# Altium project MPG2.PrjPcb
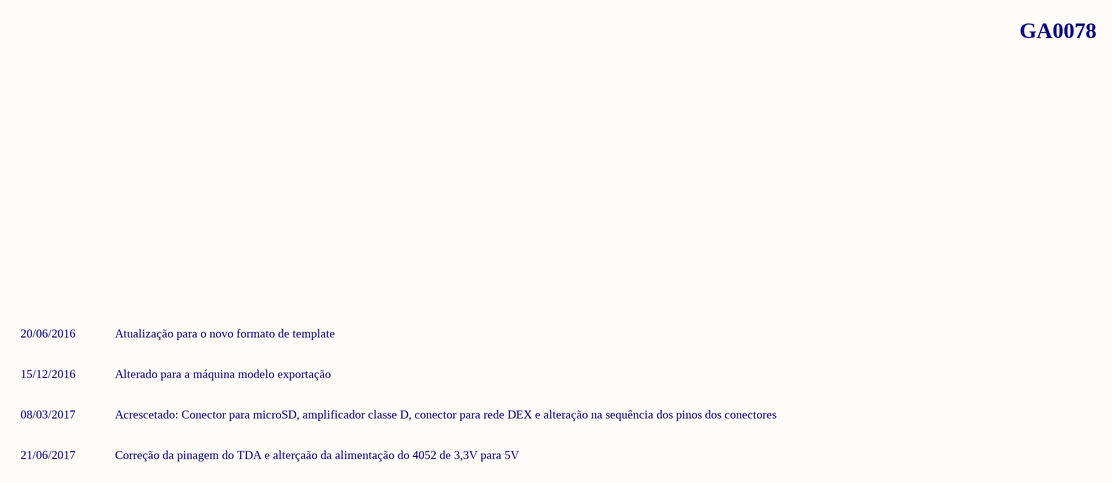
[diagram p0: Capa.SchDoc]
17 sheets, 339 parts. Net scope: global (net labels, ports and power ports of the same name join across sheets).
Sheets:
  Capa.SchDoc
  amplificadorAudio.SchDoc
  Barreira_pacote.SchDoc
  Controle_Cupula.SchDoc
  Controle_placa_potencia.SchDoc
  ControleEmbalagem.SchDoc
  ControleLeds.SchDoc
  CPU.SchDoc
  Entrada_comestero_rm5.SchDoc
  IHM.SchDoc
  Interface_gratis.SchDoc
  InterfaceConfiguracao.SchDoc
  JTAG.SchDoc
  Meios_pagamento.SchDoc
  Memoria.SchDoc
  Porta_MDB.SchDoc
  Regulador.SchDoc

## Sheet Capa.SchDoc: CONTROLADORA MAIS PIPOCA - REVISÃO EMC
size A3; Author: Marcos Aquino; DocumentNumber: 1; SheetNumber: 1; SheetTotal: 17; PageSetup: Record=PageOptions¦CenterHorizontal=True¦CenterVertical=True¦PrintScale=0.71¦XCorrection=1.00¦YCorrection=1.00¦PrintKind=0¦BorderSize=5000000¦LeftOffset=0¦BottomOffset=0¦Orientation=2¦PaperLength=1000¦PaperWidth=1000¦Scale=100¦PaperSource=7¦PrintQuality=-3¦MediaType=1¦DitherType=10¦PrintScaleMode=1¦PaperKind=A4¦PaperIndex=9

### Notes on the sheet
- GA0078
- 20/06/2016
- 15/12/2016
- Atualização para o novo formato de template
- Alterado para a máquina modelo exportação
- 08/03/2017
- Acrescetado: Conector para microSD, amplificador classe D, conector para rede DEX e alteração na sequência dos pinos dos conectores
- 21/06/2017
- Correção da pinagem do TDA e alterçaão da alimentação do 4052 de 3,3V para 5V

## Sheet amplificadorAudio.SchDoc: CONTROLADORA MAIS PIPOCA - REVISÃO EMC
size A3; DocumentNumber: GA0078; SheetNumber: 4; SheetTotal: 17
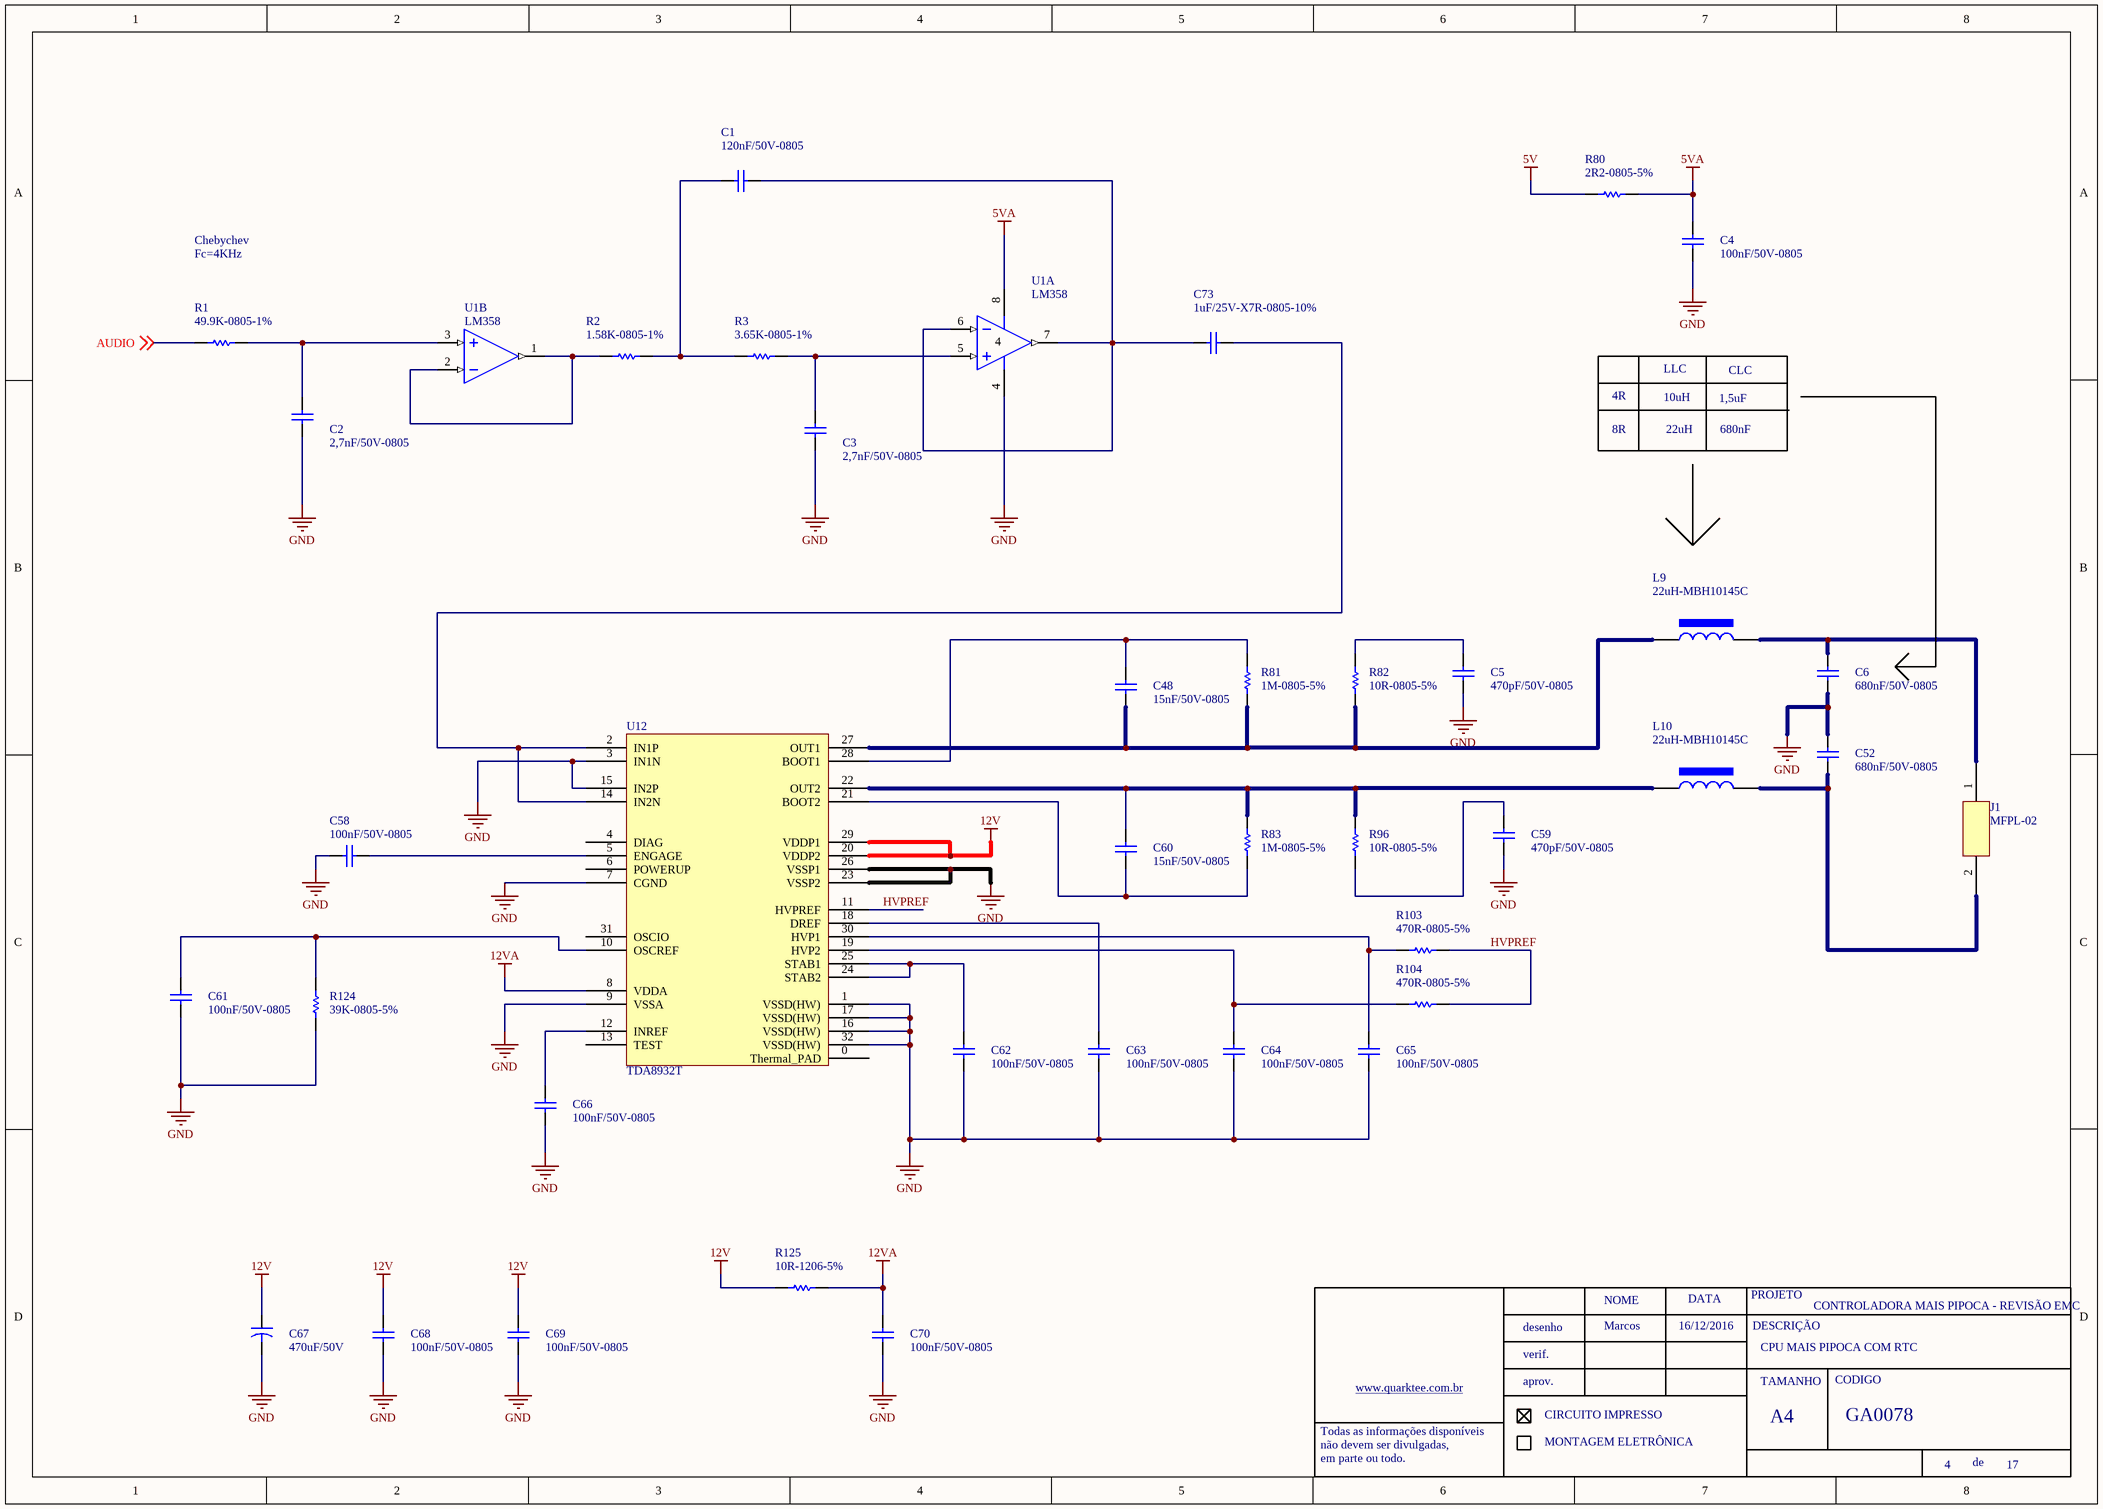
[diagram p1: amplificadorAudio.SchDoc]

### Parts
C1  120nF/50V-0805  [0805-REVISADO ONDA]
C2  2,7nF/50V-0805  [0805-REVISADO ONDA]
C3  2,7nF/50V-0805  [0805-REVISADO ONDA]
C4  100nF/50V-0805  [0805-REVISADO ONDA]
C5  470pF/50V-0805  [0805-REVISADO ONDA]
C6  680nF/50V-0805  [0805-REVISADO ONDA]
C48  15nF/50V-0805  [0805-REVISADO ONDA]
C52  680nF/50V-0805  [0805-REVISADO ONDA]
C58  100nF/50V-0805  [0805-REVISADO ONDA]
C59  470pF/50V-0805  [0805-REVISADO ONDA]
C60  15nF/50V-0805  [0805-REVISADO ONDA]
C61  100nF/50V-0805  [0805-REVISADO ONDA]
C62  100nF/50V-0805  [0805-REVISADO ONDA]
C63  100nF/50V-0805  [0805-REVISADO ONDA]
C64  100nF/50V-0805  [0805-REVISADO ONDA]
C65  100nF/50V-0805  [0805-REVISADO ONDA]
C66  100nF/50V-0805  [0805-REVISADO ONDA]
C67  470uF/50V
C68  100nF/50V-0805  [0805-REVISADO ONDA]
C69  100nF/50V-0805  [0805-REVISADO ONDA]
C70  100nF/50V-0805  [0805-REVISADO ONDA]
C73  1uF/25V-X7R-0805-10%  [0805-REVISADO ONDA]
J1  MFPL-02  [MFPL-02]
L9  22uH-MBH10145C
L10  22uH-MBH10145C
R1  49.9K-0805-1%  [0805-REVISADO ONDA]
R2  1.58K-0805-1%  [0805-REVISADO ONDA]
R3  3.65K-0805-1%  [0805-REVISADO ONDA]
R80  2R2-0805-5%
R81  1M-0805-5%  [0805-REVISADO ONDA]
R82  10R-0805-5%  [0805-REVISADO ONDA]
R83  1M-0805-5%  [0805-REVISADO ONDA]
R96  10R-0805-5%  [0805-REVISADO ONDA]
R103  470R-0805-5%  [0805-REVISADO ONDA]
R104  470R-0805-5%  [0805-REVISADO ONDA]
R124  39K-0805-5%  [0805-REVISADO ONDA]
R125  10R-1206-5%
U1  LM358  (parts A,B of 2)
U12  TDA8932T

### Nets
5V: R80.1
5VA: C4.2 R80.2 U1.8(V+)
12V: C67.1 C68.2 C69.2 R125.1 U12.20(VDDP2) U12.29(VDDP1)
12VA: C70.2 R125.2 U12.8(VDDA)
GND: C2.1 C3.1 C4.1 C5.1 C6.1 C52.2 C58.2 C59.1 C61.1 C62.1 C63.1 C64.1 C65.1 C66.1 C67.2 C68.1 C69.1 C70.1 R124.1 U1.4(GND) U12.1(VSSD(HW)) U12.3(IN1N) U12.7(CGND) U12.9(VSSA) U12.15(IN2P) U12.16(VSSD(HW)) U12.17(VSSD(HW)) U12.23(VSSP2) U12.26(VSSP1) U12.32(VSSD(HW))
AUDIO: R1.1 ; off-sheet AUDIO
HVPREF: R103.1 R104.1 U12.11(HVPREF)
NetC1_1: C1.1 C73.2 U1.6(IN-) U1.7(OUT)
NetC1_2: C1.2 R2.2 R3.1
NetC2_2: C2.2 R1.2 U1.3(IN+)
NetC3_2: C3.2 R3.2 U1.5(IN+)
NetC5_2: C5.2 R82.1
NetC6_2: C6.2 J1.1 L9.1
NetC48_1: C48.1 L9.2 R81.2 R82.2 U12.27(OUT1)
NetC48_2: C48.2 R81.1 U12.28(BOOT1)
NetC52_1: C52.1 J1.2 L10.1
NetC58_1: C58.1 U12.5(ENGAGE)
NetC59_2: C59.2 R96.2
NetC60_1: C60.1 R83.2 U12.21(BOOT2)
NetC60_2: C60.2 L10.2 R83.1 R96.1 U12.22(OUT2)
NetC61_2: C61.2 R124.2 U12.10(OSCREF)
NetC62_2: C62.2 U12.24(STAB2) U12.25(STAB1)
NetC63_2: C63.2 U12.18(DREF)
NetC64_2: C64.2 R104.2 U12.19(HVP2)
NetC65_2: C65.2 R103.2 U12.30(HVP1)
NetC66_2: C66.2 U12.12(INREF)
NetC73_1: C73.1 U12.2(IN1P) U12.14(IN2N)
NetR2_1: R2.1 U1.1(OUT) U1.2(IN-)

Not connected (* = marked no-connect by the designer): U12 0(Thermal_PAD) 4(DIAG) 6(POWERUP) 13(TEST) 31(OSCIO)

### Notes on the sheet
- Chebychev
- Fc=4KHz
- LLC
- CLC
- 4R
- 8R
- 10uH
- 22uH
- 1,5uF
- 680nF
- Marcos
- 16/12/2016
- CPU MAIS PIPOCA COM RTC

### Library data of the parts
C1-C3 C5 C6 C48 C52 C59 C60 C73 = 100nF/50-0805-NPO: 100nF/50V-0805
C4 C58 C61-C66 C68-C70 = 100nF/50-0805-NPO
L9 L10 = indutor 1mH CNF15: 1mH-CNF15-26 AWG
R1-R3 R81-R83 R96 R103 R104 R124 = 10K-0805-5%
R80 R125 = 10R-0805-5%
U1 = LM358: ERP: 10802003

## Sheet Barreira_pacote.SchDoc: CONTROLADORA MAIS PIPOCA - REVISÃO EMC
size A3; DocumentNumber: GA0078; SheetNumber: 16; SheetTotal: 17
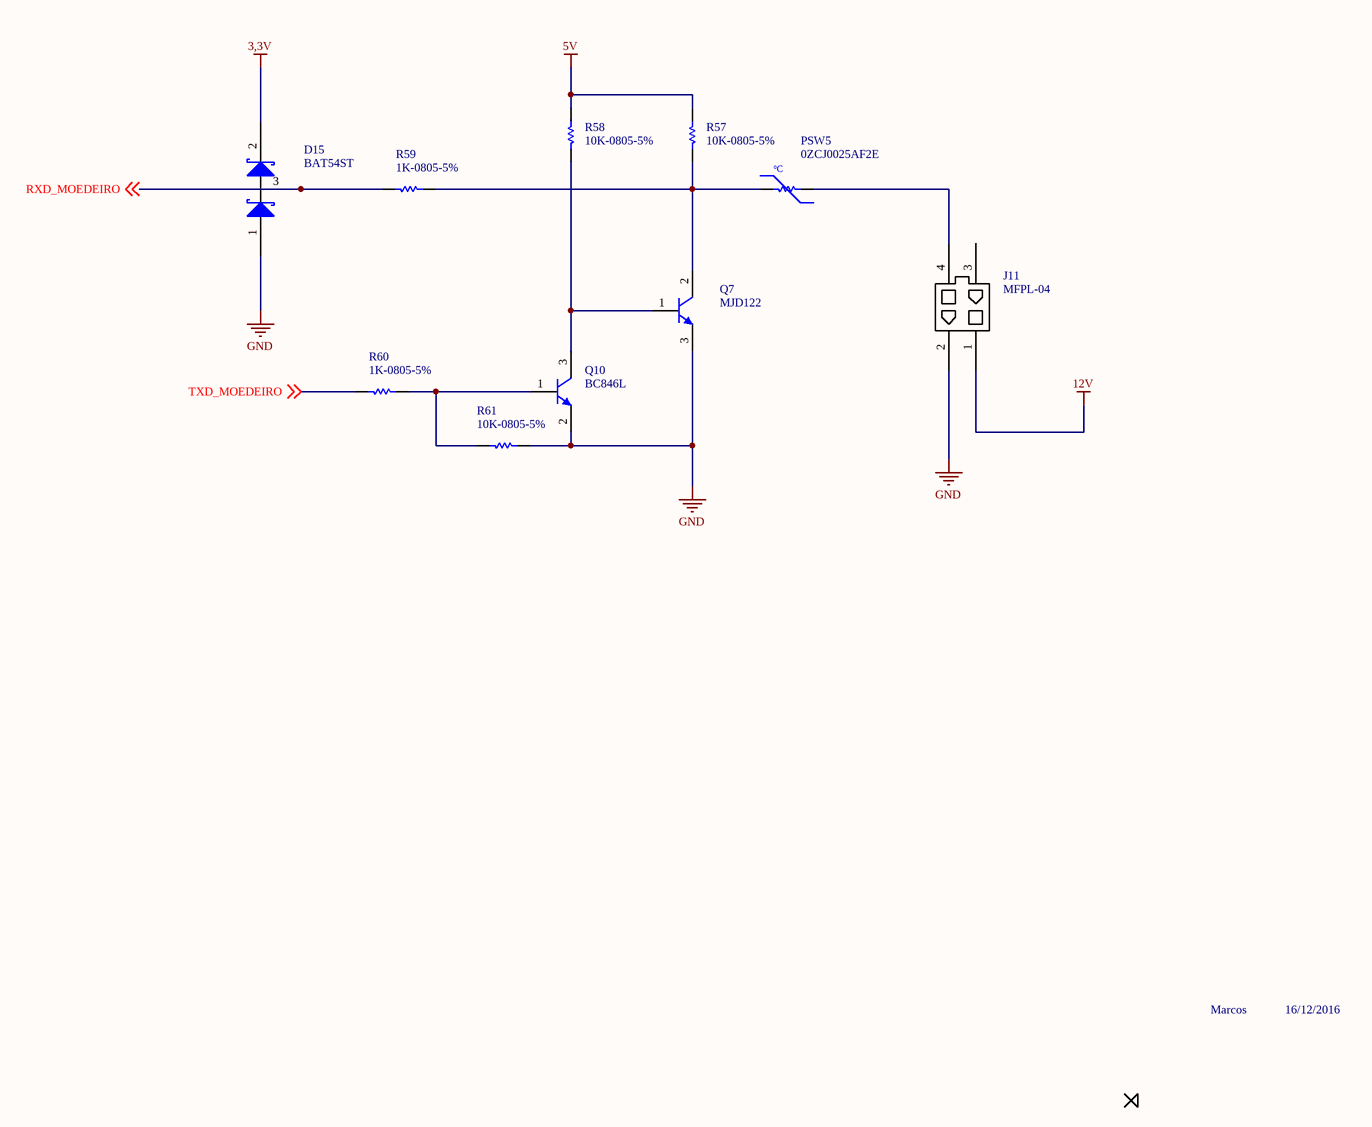
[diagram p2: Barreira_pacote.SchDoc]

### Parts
D15  BAT54ST  [SOT23 - REVISADO ONDA]
J11  MFPL-04
PSW5  0ZCJ0025AF2E  [1206-REVISADO ONDA]
Q7  MJD122  [DPAK REVISADO ONDA]
Q10  BC846L  [SOT23 - REVISADO ONDA]
R57  10K-0805-5%  [0805-REVISADO ONDA]
R58  10K-0805-5%  [0805-REVISADO ONDA]
R59  1K-0805-5%  [0805-REVISADO ONDA]
R60  1K-0805-5%  [0805-REVISADO ONDA]
R61  10K-0805-5%  [0805-REVISADO ONDA]

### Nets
3,3V: D15.2
5V: R57.2 R58.2
12V: J11.1
GND: D15.1 J11.2 Q7.3(E) Q10.2(E) R61.1
RXD_MOEDEIRO: D15.3 R59.2 ; off-sheet RXD_MOEDEIRO
TXD_MOEDEIRO: R60.2 ; off-sheet TXD_MOEDEIRO
NetJ11_4: J11.4 PSW5.1
NetPSW5_2: PSW5.2 Q7.2(C) R57.1 R59.1
NetQ7_1: Q7.1(B) Q10.3(C) R58.1
NetQ10_1: Q10.1(B) R60.1 R61.2

Not connected (* = marked no-connect by the designer): J11 3

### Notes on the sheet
- Marcos
- 16/12/2016

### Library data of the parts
PSW5 = PTC 2A-120V
Q7 = MJD31
Q10 = BC846

## Sheet Controle_Cupula.SchDoc: CONTROLADORA MAIS PIPOCA - REVISÃO EMC
size A3; DocumentNumber: GA0078; SheetNumber: 6; SheetTotal: 17
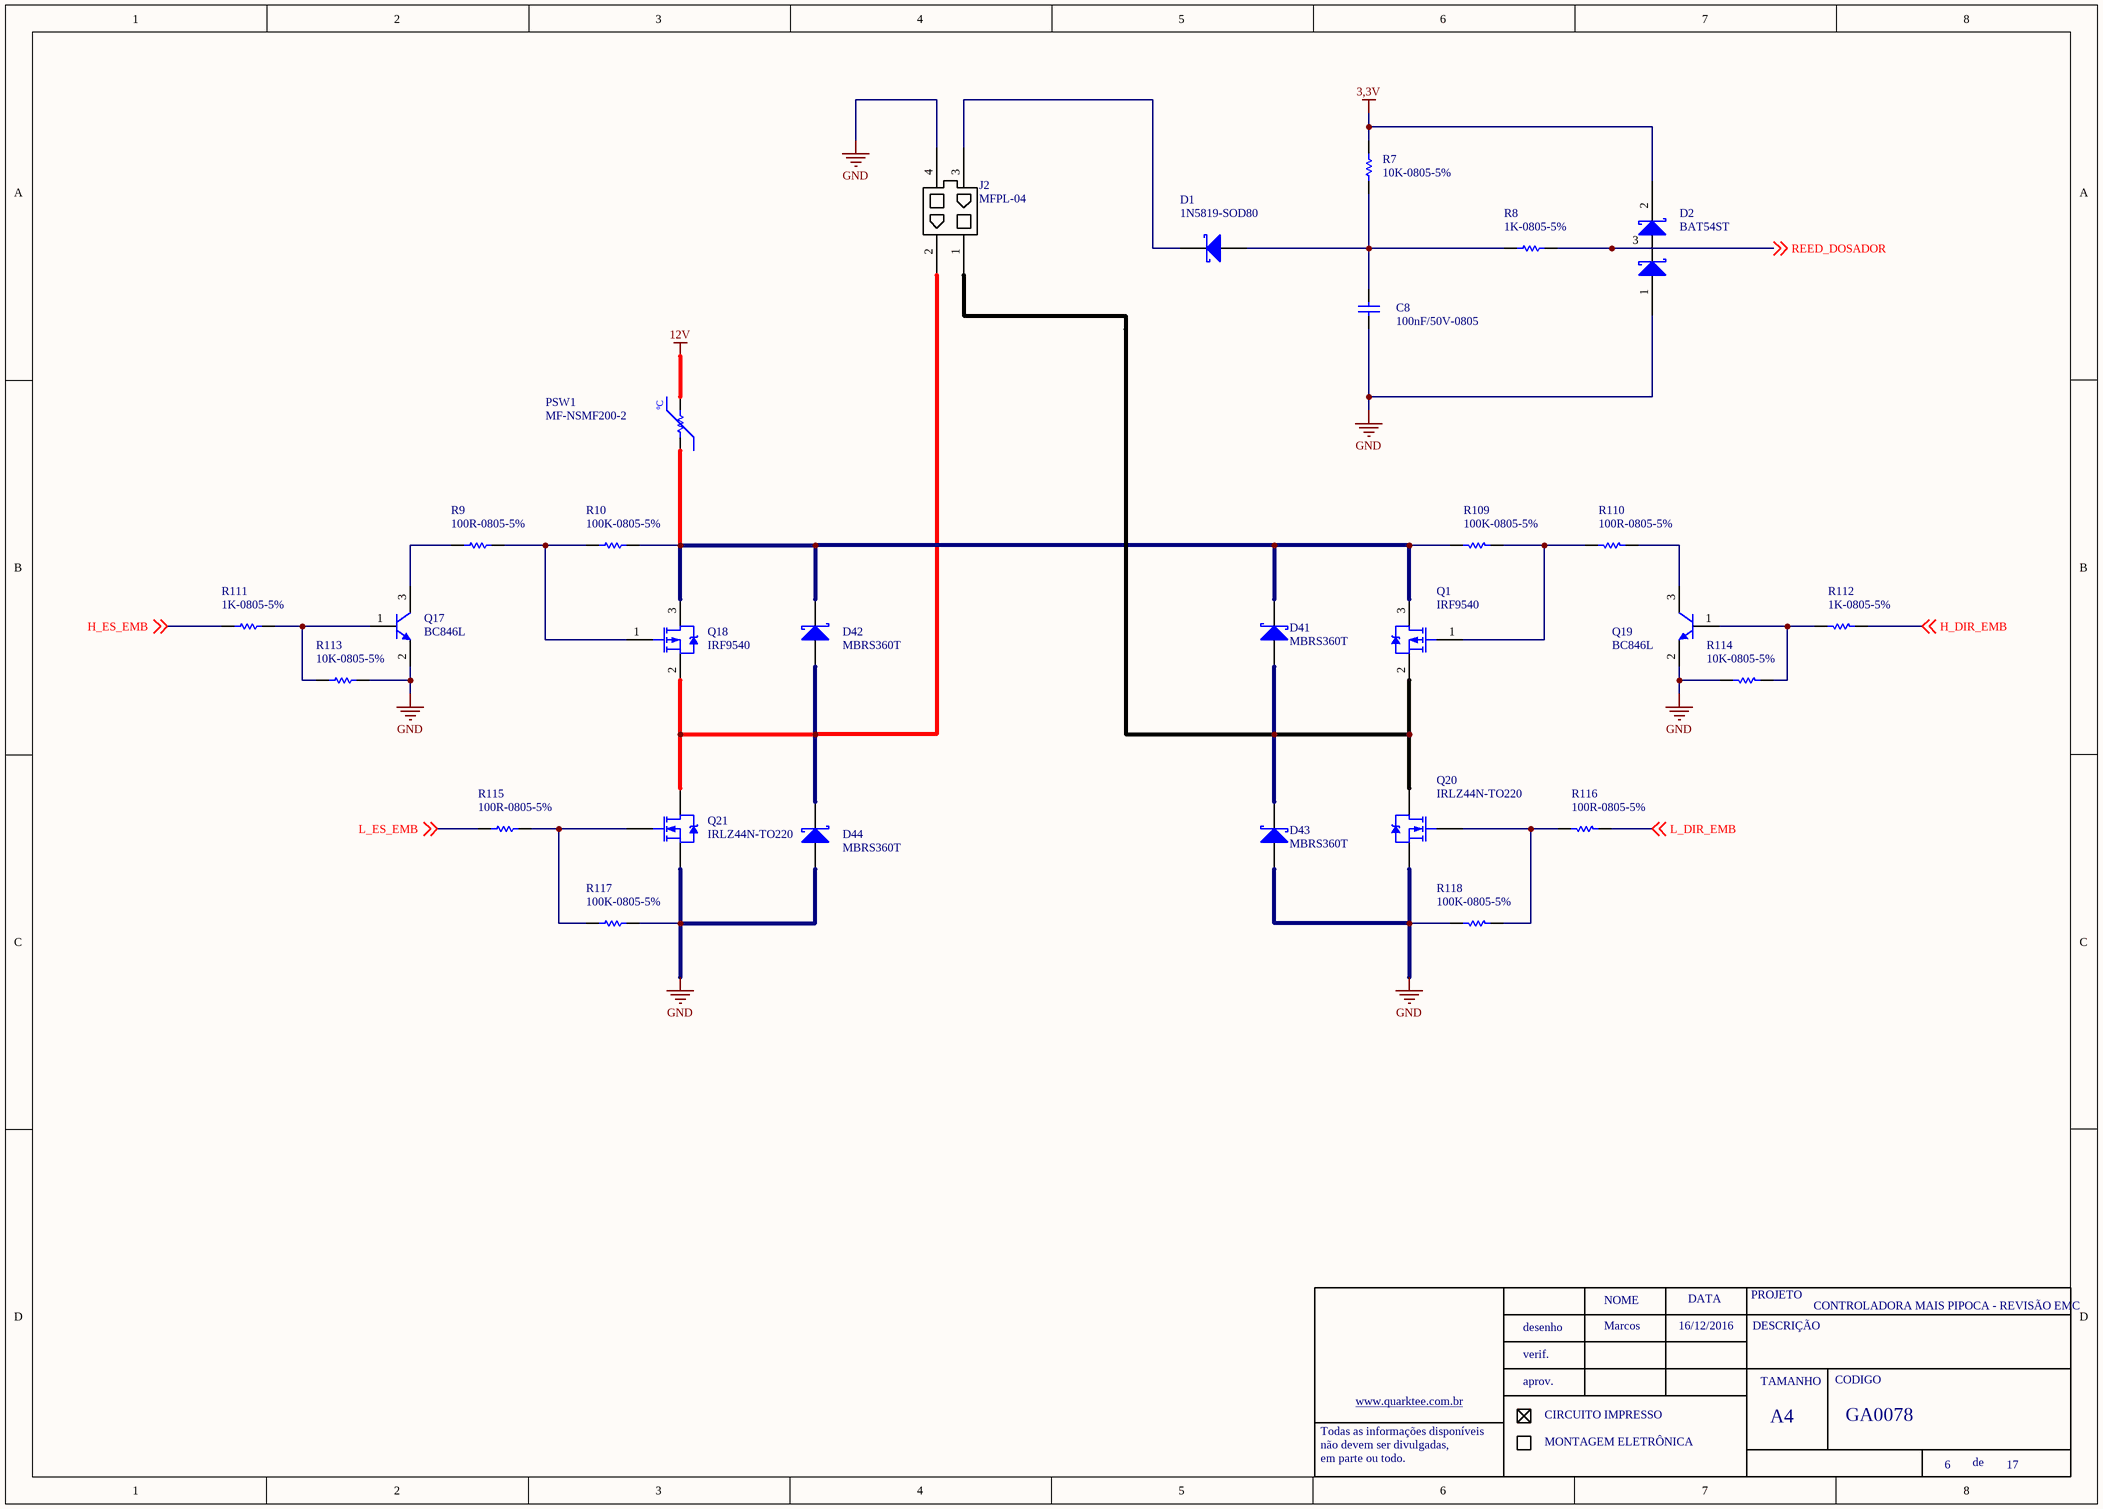
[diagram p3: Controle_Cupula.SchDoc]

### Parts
C8  100nF/50V-0805  [0805-REVISADO ONDA]
D1  1N5819-SOD80  [MINIMLEF/SOD80 - REVISADO ONDA]
D2  BAT54ST  [SOT23 - REVISADO ONDA]
D41  MBRS360T  [DO-214AB]
D42  MBRS360T  [DO-214AB]
D43  MBRS360T  [DO-214AB]
D44  MBRS360T  [DO-214AB]
J2  MFPL-04
PSW1  MF-NSMF200-2  [1206-REVISADO ONDA]
Q1  IRF9540  [TO220-3 EM PÉ]
Q17  BC846L  [SOT23 - REVISADO ONDA]
Q18  IRF9540  [TO220-3 EM PÉ]
Q19  BC846L  [SOT23 - REVISADO ONDA]
Q20  IRLZ44N-TO220  [TO220-3 EM PÉ]
Q21  IRLZ44N-TO220  [TO220-3 EM PÉ]
R7  10K-0805-5%  [0805-REVISADO ONDA]
R8  1K-0805-5%  [0805-REVISADO ONDA]
R9  100R-0805-5%  [0805-REVISADO ONDA]
R10  100K-0805-5%  [0805-REVISADO ONDA]
R109  100K-0805-5%  [0805-REVISADO ONDA]
R110  100R-0805-5%  [0805-REVISADO ONDA]
R111  1K-0805-5%  [0805-REVISADO ONDA]
R112  1K-0805-5%  [0805-REVISADO ONDA]
R113  10K-0805-5%  [0805-REVISADO ONDA]
R114  10K-0805-5%  [0805-REVISADO ONDA]
R115  100R-0805-5%  [0805-REVISADO ONDA]
R116  100R-0805-5%  [0805-REVISADO ONDA]
R117  100K-0805-5%  [0805-REVISADO ONDA]
R118  100K-0805-5%  [0805-REVISADO ONDA]

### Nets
3,3V: D2.2 R7.2
12V: PSW1.2
GND: C8.1 D2.1 D43.1(A) D44.1(A) J2.4 Q17.2(E) Q19.2(E) Q20.3(S) Q21.3(S) R113.2 R114.2 R117.2 R118.2
H_DIR_EMB: R112.1 ; off-sheet H_DIR_EMB
H_ES_EMB: R111.1 ; off-sheet H_ES_EMB
L_DIR_EMB: R116.1 ; off-sheet L_DIR_EMB
L_ES_EMB: R115.1 ; off-sheet L_ES_EMB
REED_DOSADOR: D2.3 R8.2 ; off-sheet REED_DOSADOR
NetC8_2: C8.2 D1.1(A) R7.1 R8.1
NetD1_2: D1.2(K) J2.3
NetD41_1: D41.1(A) D43.2(K) J2.1 Q1.2(DRENO) Q20.2(D)
NetD41_2: D41.2(K) D42.2(K) PSW1.1 Q1.3(SOURCE) Q18.3(SOURCE) R10.2 R109.2
NetD42_1: D42.1(A) D44.2(K) J2.2 Q18.2(DRENO) Q21.2(D)
NetQ1_1: Q1.1(GATE) R109.1 R110.2
NetQ17_1: Q17.1(B) R111.2 R113.1
NetQ17_3: Q17.3(C) R9.1
NetQ18_1: Q18.1(GATE) R9.2 R10.1
NetQ19_1: Q19.1(B) R112.2 R114.1
NetQ19_3: Q19.3(C) R110.1
NetQ20_1: Q20.1(G) R116.2 R118.1
NetQ21_1: Q21.1(G) R115.2 R117.1

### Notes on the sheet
- Marcos
- 16/12/2016

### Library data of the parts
C8 = 100nF/50-0805-NPO
D41-D44 = 1N5819-SOD80
PSW1 = POLYSWITCH 200mA: NANOSMDC020F-2
Q17 Q19 = BC846
R9 R110 = 1K-0805-5%
R111 R112 = 10K-0805-5%

## Sheet Controle_placa_potencia.SchDoc: CONTROLADORA MAIS PIPOCA - REVISÃO EMC
size A3; DocumentNumber: GA0078; SheetNumber: 8; SheetTotal: 17
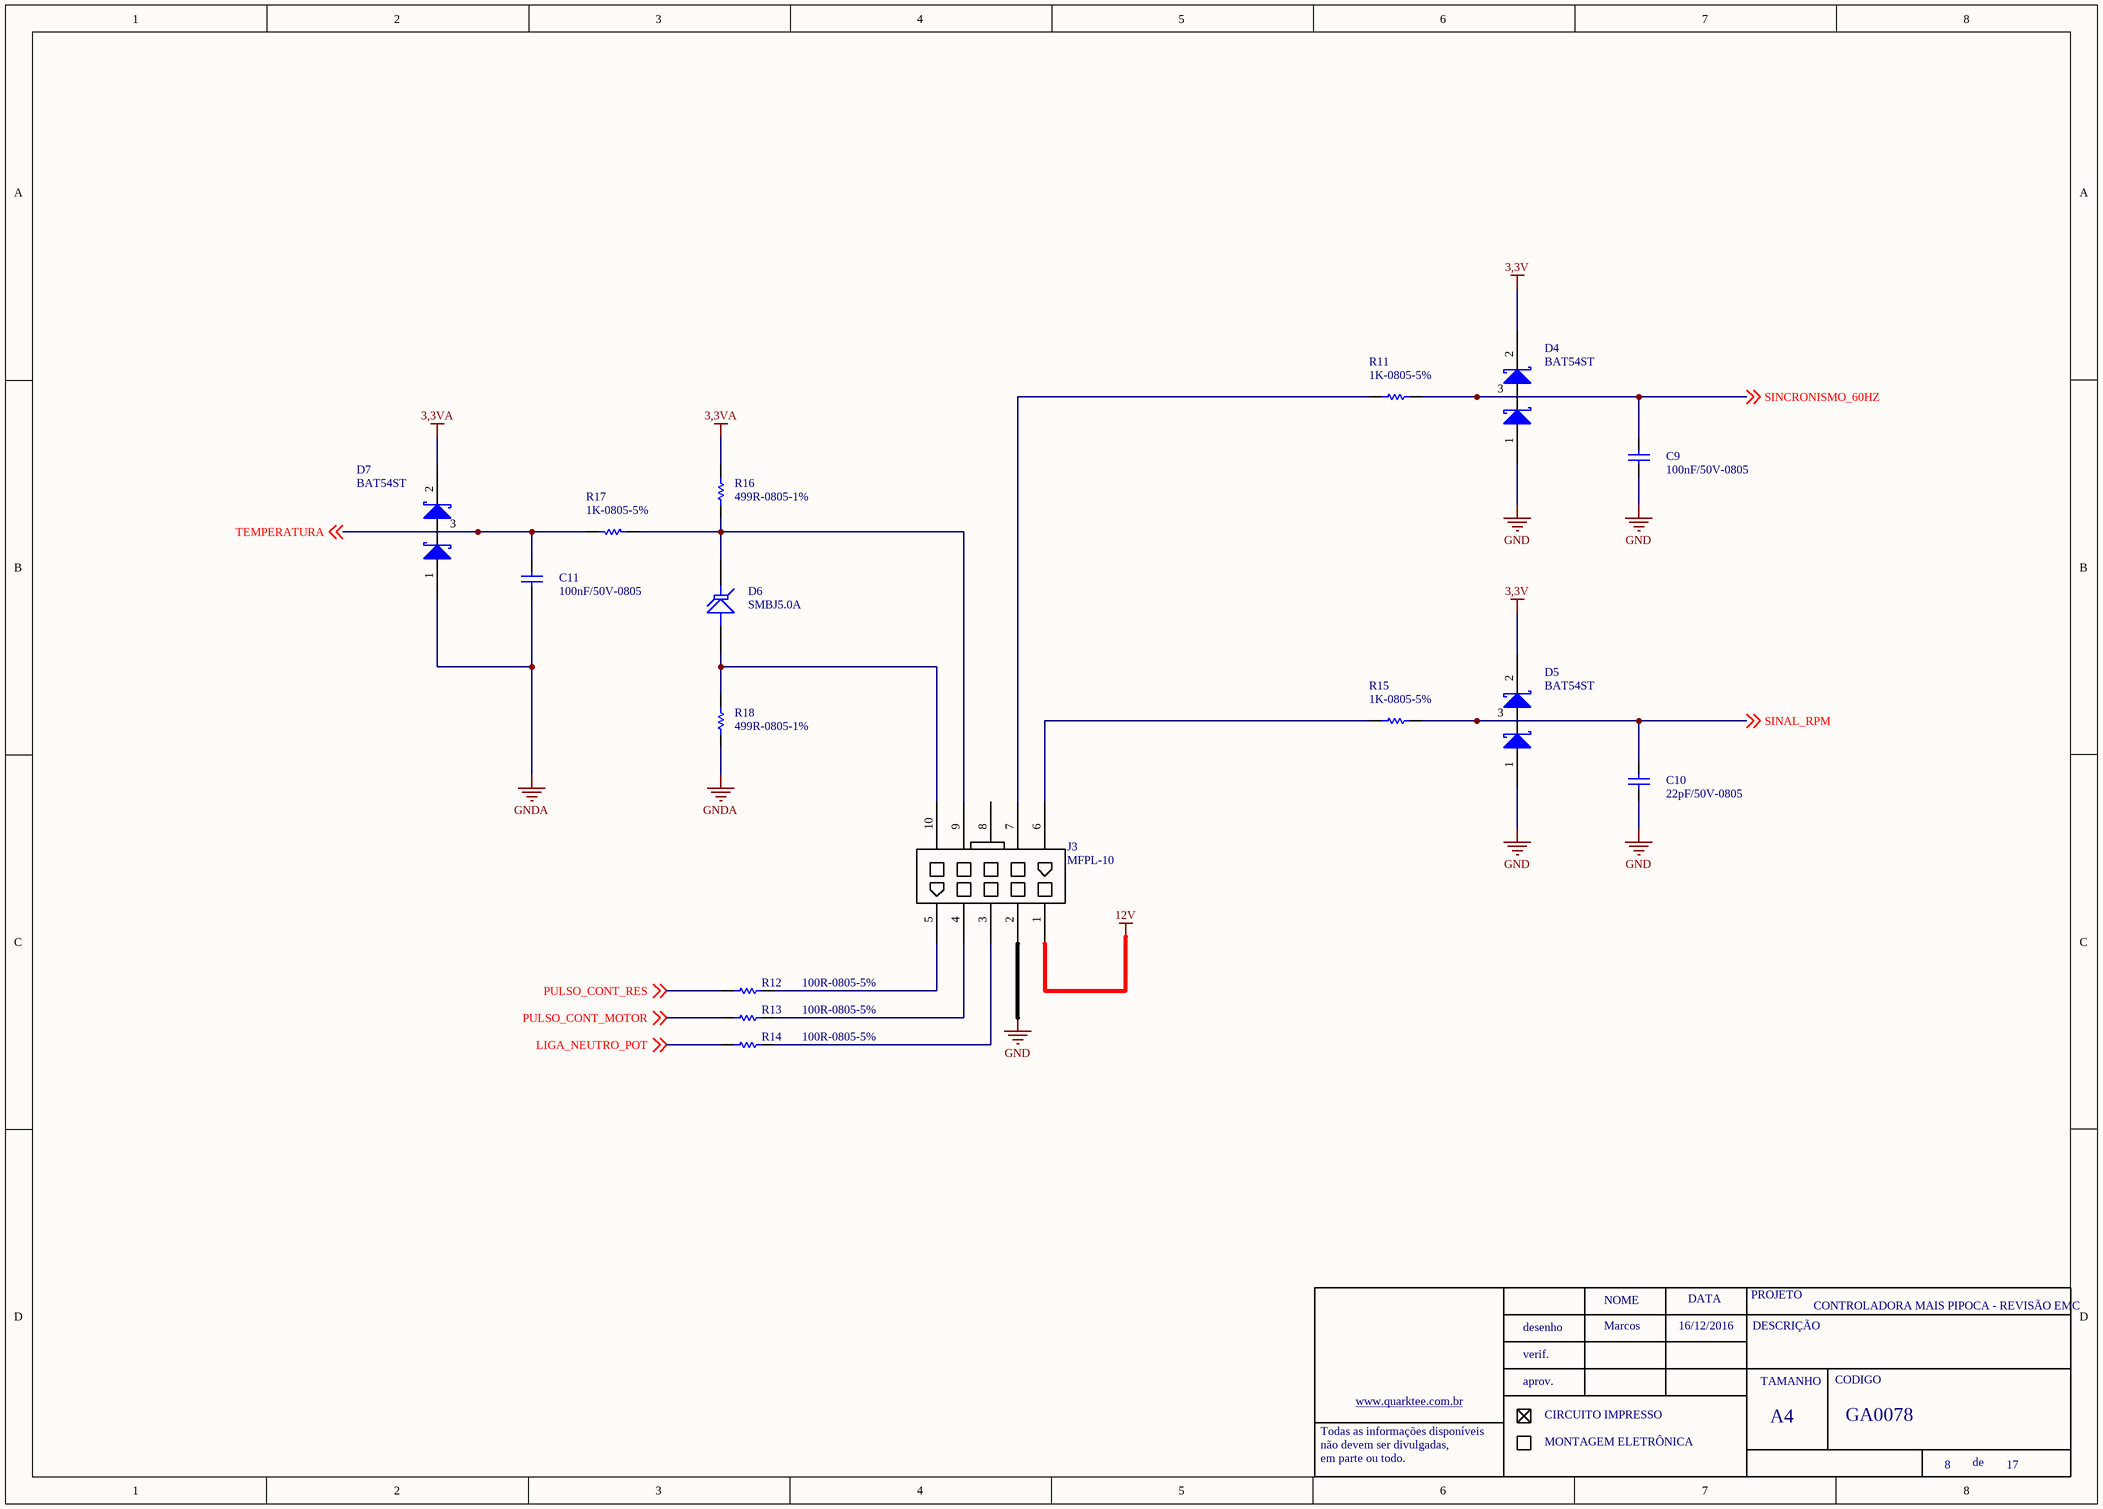
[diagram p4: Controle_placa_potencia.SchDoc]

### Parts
C9  100nF/50V-0805  [0805-REVISADO ONDA]
C10  22pF/50V-0805  [0805-REVISADO ONDA]
C11  100nF/50V-0805  [0805-REVISADO ONDA]
D4  BAT54ST  [SOT23 - REVISADO ONDA]
D5  BAT54ST  [SOT23 - REVISADO ONDA]
D6  SMBJ5.0A  [SMA DIODES]
D7  BAT54ST  [SOT23 - REVISADO ONDA]
J3  MFPL-10
R11  1K-0805-5%  [0805-REVISADO ONDA]
R12  100R-0805-5%  [0805-REVISADO ONDA]
R13  100R-0805-5%  [0805-REVISADO ONDA]
R14  100R-0805-5%  [0805-REVISADO ONDA]
R15  1K-0805-5%  [0805-REVISADO ONDA]
R16  499R-0805-1%  [0805-REVISADO ONDA]
R17  1K-0805-5%  [0805-REVISADO ONDA]
R18  499R-0805-1%  [0805-REVISADO ONDA]

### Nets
3,3V: D4.2 D5.2
3,3VA: D7.2 R16.2
12V: J3.1
GND: C9.2 C10.2 D4.1 D5.1 J3.2
GNDA: C11.1 D7.1 R18.1
LIGA_NEUTRO_POT: R14.1 ; off-sheet LIGA_NEUTRO_POT
PULSO_CONT_MOTOR: R13.1 ; off-sheet PULSO_CONT_MOTOR
PULSO_CONT_RES: R12.2 ; off-sheet PULSO_CONT_RES
SINAL_RPM: C10.1 D5.3 R15.2 ; off-sheet SINAL_RPM
SINCRONISMO_60HZ: C9.1 D4.3 R11.2 ; off-sheet SINCRONISMO_60HZ
TEMPERATURA: C11.2 D7.3 R17.2 ; off-sheet TEMPERATURA
NetD6_1: D6.1(A) J3.10 R18.2
NetD6_2: D6.2(K) J3.9 R16.1 R17.1
NetJ3_3: J3.3 R14.2
NetJ3_4: J3.4 R13.2
NetJ3_5: J3.5 R12.1
NetJ3_6: J3.6 R15.1
NetJ3_7: J3.7 R11.1

Not connected (* = marked no-connect by the designer): J3 8

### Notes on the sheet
- Marcos
- 16/12/2016

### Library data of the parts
C9 C11 = 100nF/50-0805-NPO
C10 = 100nF/50-0805-NPO: 100nF/50V-0805
R16 R18 = 10K-0805-5%

## Sheet ControleEmbalagem.SchDoc: CONTROLADORA MAIS PIPOCA - REVISÃO EMC
size A3; DocumentNumber: GA0078; SheetNumber: 5; SheetTotal: 17
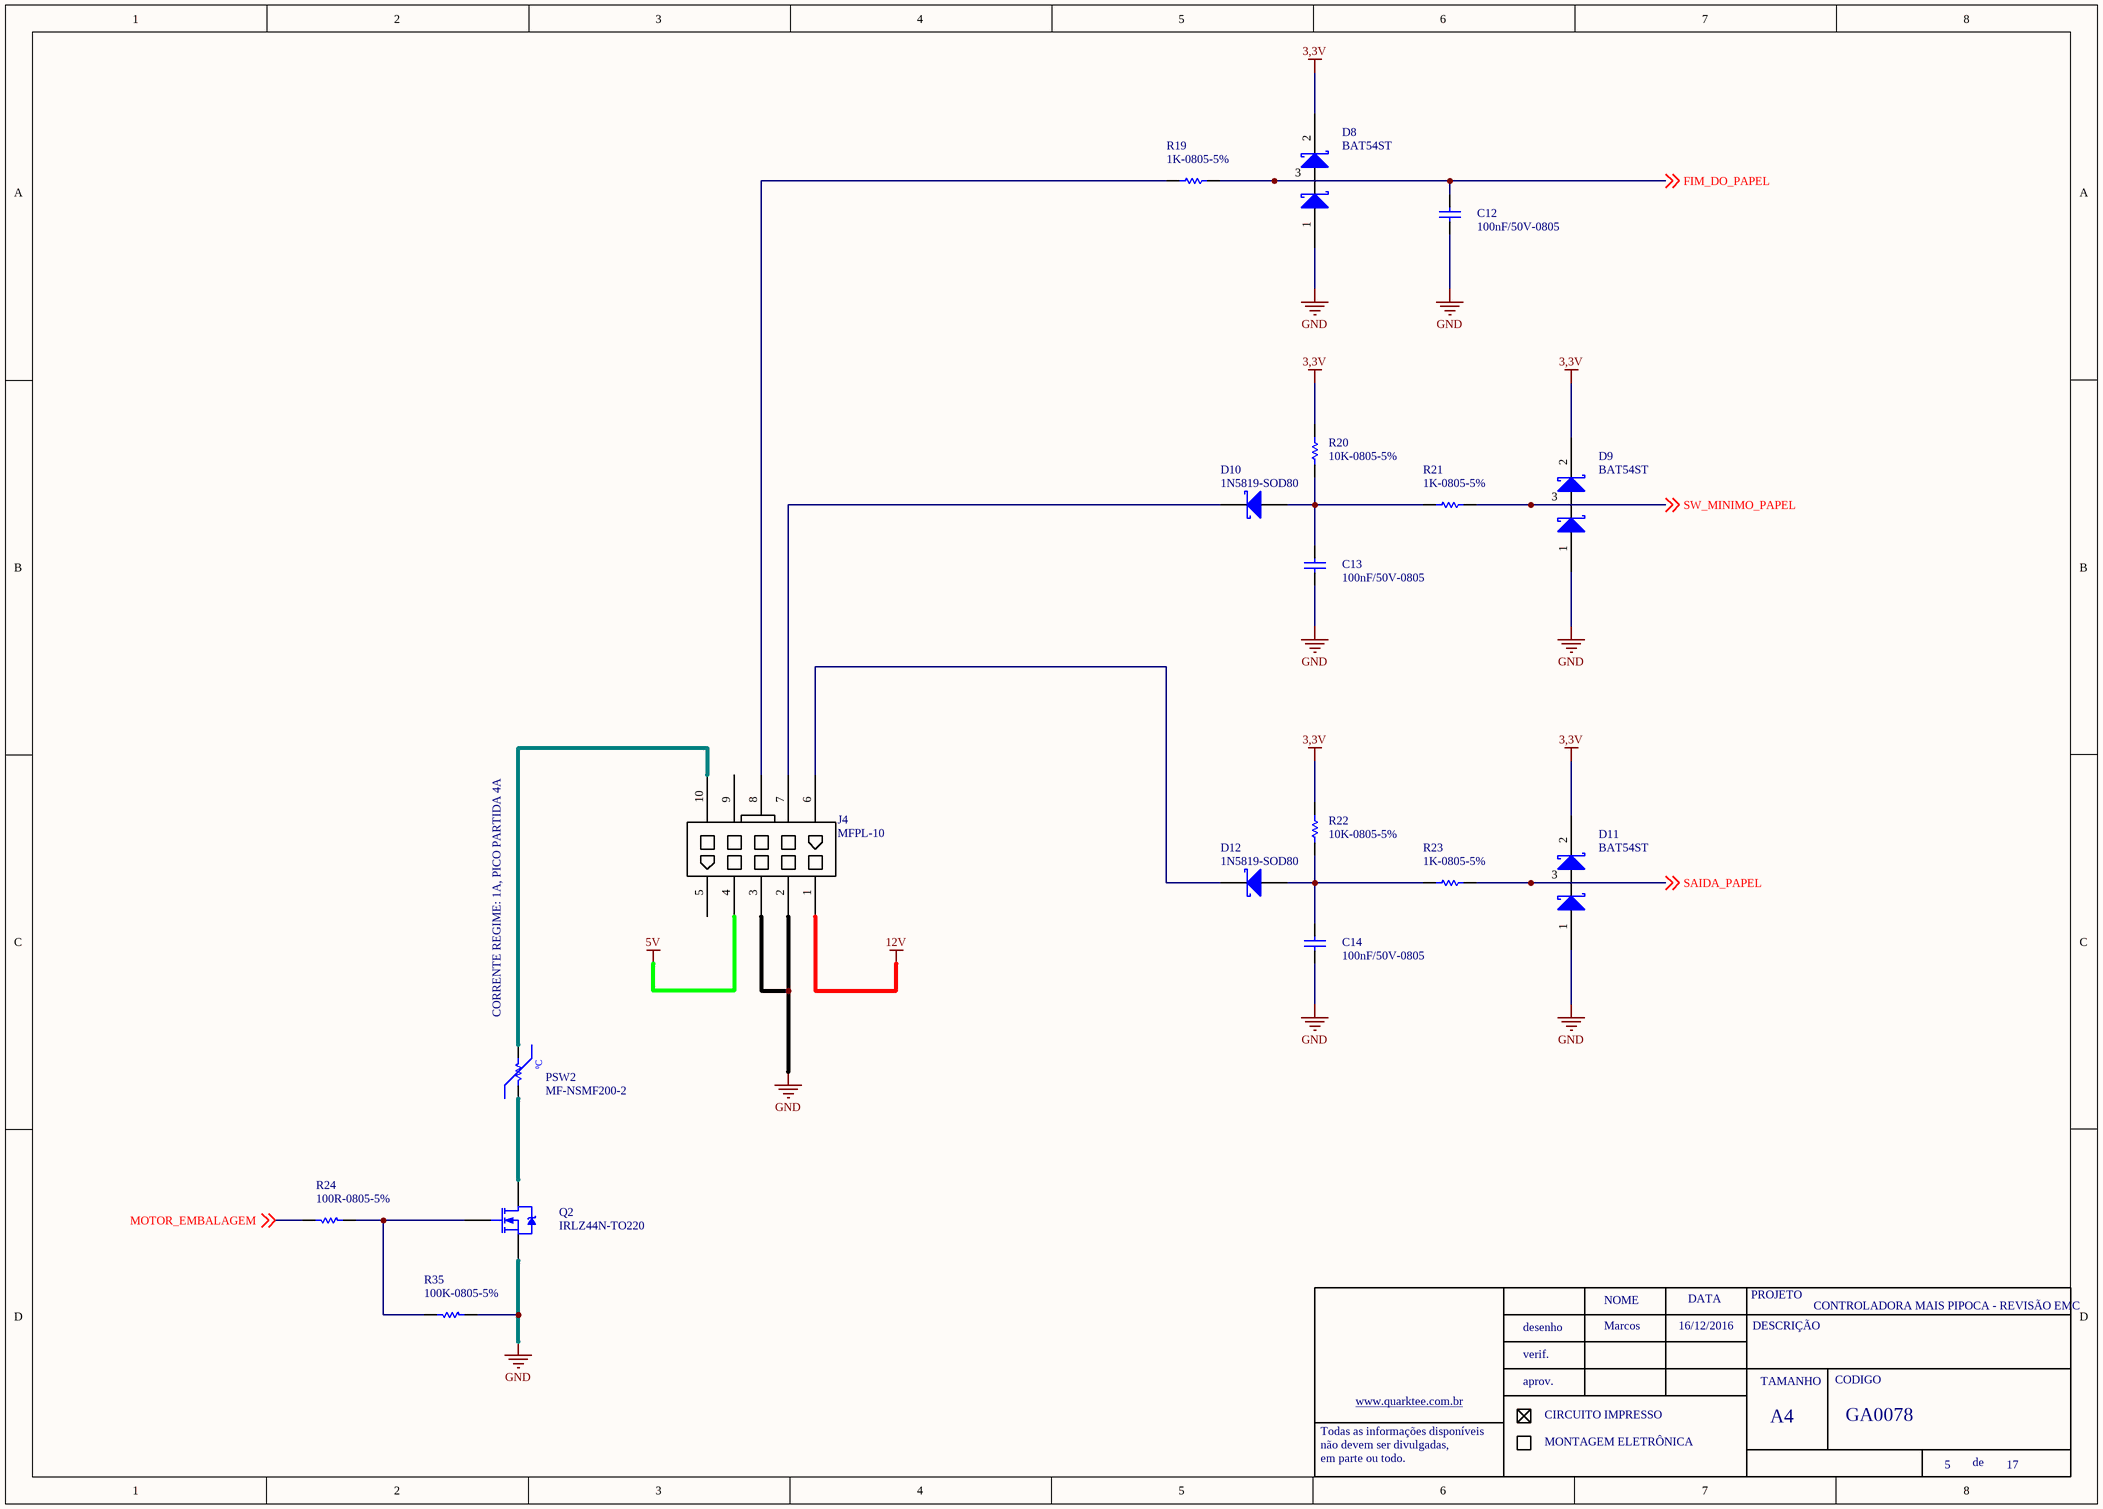
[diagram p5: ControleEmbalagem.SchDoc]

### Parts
C12  100nF/50V-0805  [0805-REVISADO ONDA]
C13  100nF/50V-0805  [0805-REVISADO ONDA]
C14  100nF/50V-0805  [0805-REVISADO ONDA]
D8  BAT54ST  [SOT23 - REVISADO ONDA]
D9  BAT54ST  [SOT23 - REVISADO ONDA]
D10  1N5819-SOD80  [MINIMLEF/SOD80 - REVISADO ONDA]
D11  BAT54ST  [SOT23 - REVISADO ONDA]
D12  1N5819-SOD80  [MINIMLEF/SOD80 - REVISADO ONDA]
J4  MFPL-10
PSW2  MF-NSMF200-2  [1206-REVISADO ONDA]
Q2  IRLZ44N-TO220  [TO220-3 EM PÉ]
R19  1K-0805-5%  [0805-REVISADO ONDA]
R20  10K-0805-5%  [0805-REVISADO ONDA]
R21  1K-0805-5%  [0805-REVISADO ONDA]
R22  10K-0805-5%  [0805-REVISADO ONDA]
R23  1K-0805-5%  [0805-REVISADO ONDA]
R24  100R-0805-5%  [0805-REVISADO ONDA]
R35  100K-0805-5%  [0805-REVISADO ONDA]

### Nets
3,3V: D8.2 D9.2 D11.2 R20.2 R22.2
5V: J4.4
12V: J4.1
GND: C12.1 C13.1 C14.1 D8.1 D9.1 D11.1 J4.2 J4.3 Q2.3(S) R35.1
FIM_DO_PAPEL: C12.2 D8.3 R19.2 ; off-sheet FIM_DO_PAPEL
MOTOR_EMBALAGEM: R24.2 ; off-sheet MOTOR_EMBALAGEM
SAIDA_PAPEL: D11.3 R23.2 ; off-sheet SAIDA_PAPEL
SW_MINIMO_PAPEL: D9.3 R21.2 ; off-sheet SW_MINIMO_PAPEL
NetC13_2: C13.2 D10.1(A) R20.1 R21.1
NetC14_2: C14.2 D12.1(A) R22.1 R23.1
NetD10_2: D10.2(K) J4.7
NetD12_2: D12.2(K) J4.6
NetJ4_8: J4.8 R19.1
NetJ4_10: J4.10 PSW2.2
NetPSW2_1: PSW2.1 Q2.2(D)
NetQ2_1: Q2.1(G) R24.1 R35.2

Not connected (* = marked no-connect by the designer): J4 5 9

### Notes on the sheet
- (near PSW2) CORRENTE REGIME: 1A, PICO PARTIDA 4A
- Marcos
- 16/12/2016

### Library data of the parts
C12-C14 = 100nF/50-0805-NPO
PSW2 = POLYSWITCH 200mA: NANOSMDC020F-2

## Sheet ControleLeds.SchDoc: CONTROLADORA MAIS PIPOCA - REVISÃO EMC
size A3; DocumentNumber: GA0078; SheetNumber: 7; SheetTotal: 17
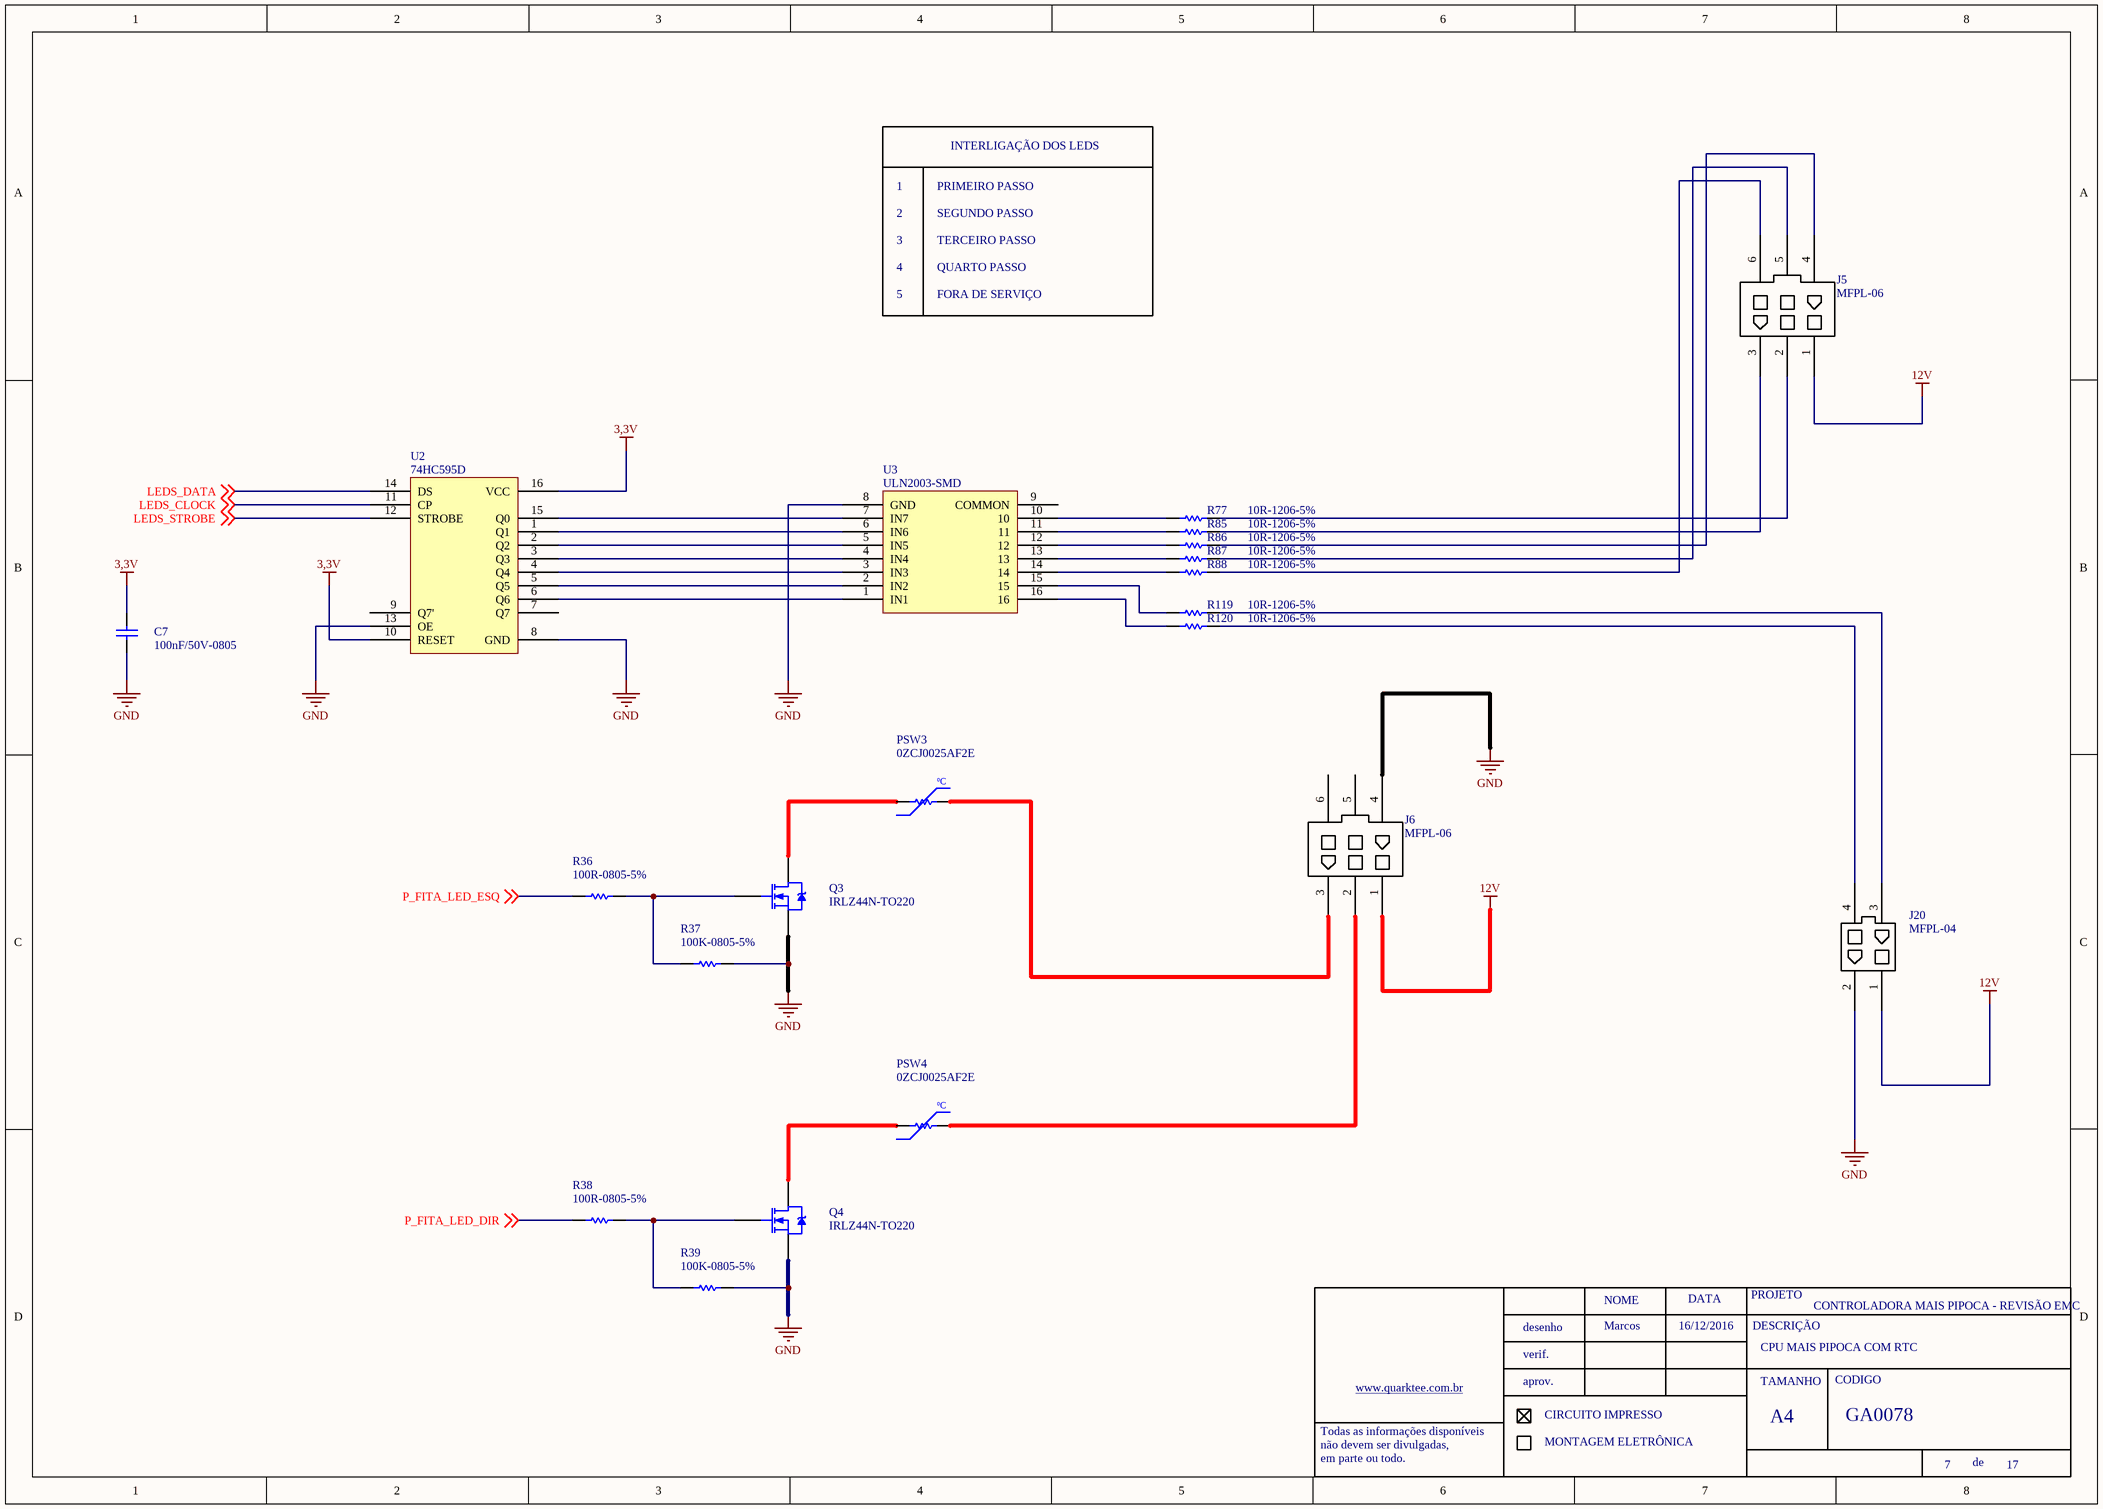
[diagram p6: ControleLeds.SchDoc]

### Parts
C7  100nF/50V-0805  [0805-REVISADO ONDA]
J5  MFPL-06
J6  MFPL-06
J20  MFPL-04
PSW3  0ZCJ0025AF2E  [1206-REVISADO ONDA]
PSW4  0ZCJ0025AF2E  [1206-REVISADO ONDA]
Q3  IRLZ44N-TO220  [TO220-3 EM PÉ]
Q4  IRLZ44N-TO220  [TO220-3 EM PÉ]
R36  100R-0805-5%  [0805-REVISADO ONDA]
R37  100K-0805-5%  [0805-REVISADO ONDA]
R38  100R-0805-5%  [0805-REVISADO ONDA]
R39  100K-0805-5%  [0805-REVISADO ONDA]
R77  10R-1206-5%  [1206-REVISADO ONDA]
R85  10R-1206-5%  [1206-REVISADO ONDA]
R86  10R-1206-5%  [1206-REVISADO ONDA]
R87  10R-1206-5%  [1206-REVISADO ONDA]
R88  10R-1206-5%  [1206-REVISADO ONDA]
R119  10R-1206-5%  [1206-REVISADO ONDA]
R120  10R-1206-5%  [1206-REVISADO ONDA]
U2  74HC595D  [SOIC 16 PINOS]
U3  ULN2003-SMD  [SOIC 16 PINOS]

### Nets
3,3V: C7.2 U2.10(RESET) U2.16(VCC)
12V: J5.1 J6.1 J20.1
GND: C7.1 J6.4 J20.2 Q3.3(S) Q4.3(S) R37.2 R39.2 U2.8(GND) U2.13(OE) U3.8(GND)
LEDS_CLOCK: U2.11(CP) ; off-sheet LEDS_CLOCK
LEDS_DATA: U2.14(DS) ; off-sheet LEDS_DATA
LEDS_STROBE: U2.12(STROBE) ; off-sheet LEDS_STROBE
P_FITA_LED_DIR: R38.1 ; off-sheet P_FITA_LED_DIR
P_FITA_LED_ESQ: R36.1 ; off-sheet P_FITA_LED_ESQ
NetJ5_2: J5.2 R77.2
NetJ5_3: J5.3 R85.2
NetJ5_4: J5.4 R86.2
NetJ5_5: J5.5 R87.2
NetJ5_6: J5.6 R88.2
NetJ6_2: J6.2 PSW4.2
NetJ6_3: J6.3 PSW3.2
NetJ20_3: J20.3 R119.2
NetJ20_4: J20.4 R120.2
NetPSW3_1: PSW3.1 Q3.2(D)
NetPSW4_1: PSW4.1 Q4.2(D)
NetQ3_1: Q3.1(G) R36.2 R37.1
NetQ4_1: Q4.1(G) R38.2 R39.1
NetR77_1: R77.1 U3.10
NetR85_1: R85.1 U3.11
NetR86_1: R86.1 U3.12
NetR87_1: R87.1 U3.13
NetR88_1: R88.1 U3.14
NetR119_1: R119.1 U3.15
NetR120_1: R120.1 U3.16
NetU2_1: U2.1(Q1) U3.6(IN6)
NetU2_2: U2.2(Q2) U3.5(IN5)
NetU2_3: U2.3(Q3) U3.4(IN4)
NetU2_4: U2.4(Q4) U3.3(IN3)
NetU2_5: U2.5(Q5) U3.2(IN2)
NetU2_6: U2.6(Q6) U3.1(IN1)
NetU2_15: U2.15(Q0) U3.7(IN7)

Not connected (* = marked no-connect by the designer): J6 5 6; U2 7(Q7) 9(Q7'); U3 9(COMMON)

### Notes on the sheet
- INTERLIGAÇÃO DOS LEDS
- 1
- 2
- 3
- PRIMEIRO PASSO
- SEGUNDO PASSO
- TERCEIRO PASSO
- 4
- 5
- QUARTO PASSO
- FORA DE SERVIÇO
- Marcos
- 16/12/2016
- CPU MAIS PIPOCA COM RTC

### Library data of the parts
C7 = 100nF/50-0805-NPO
PSW3 PSW4 = PTC 2A-120V
R77 R85-R88 R119 R120 = 10R-0805-5%
U2 = 74HC595D: ERP: CADASTRAR
U3 = ULN2003

## Sheet CPU.SchDoc: CONTROLADORA MAIS PIPOCA - REVISÃO EMC
size A3; DocumentNumber: GA0078; SheetNumber: 3; SheetTotal: 17
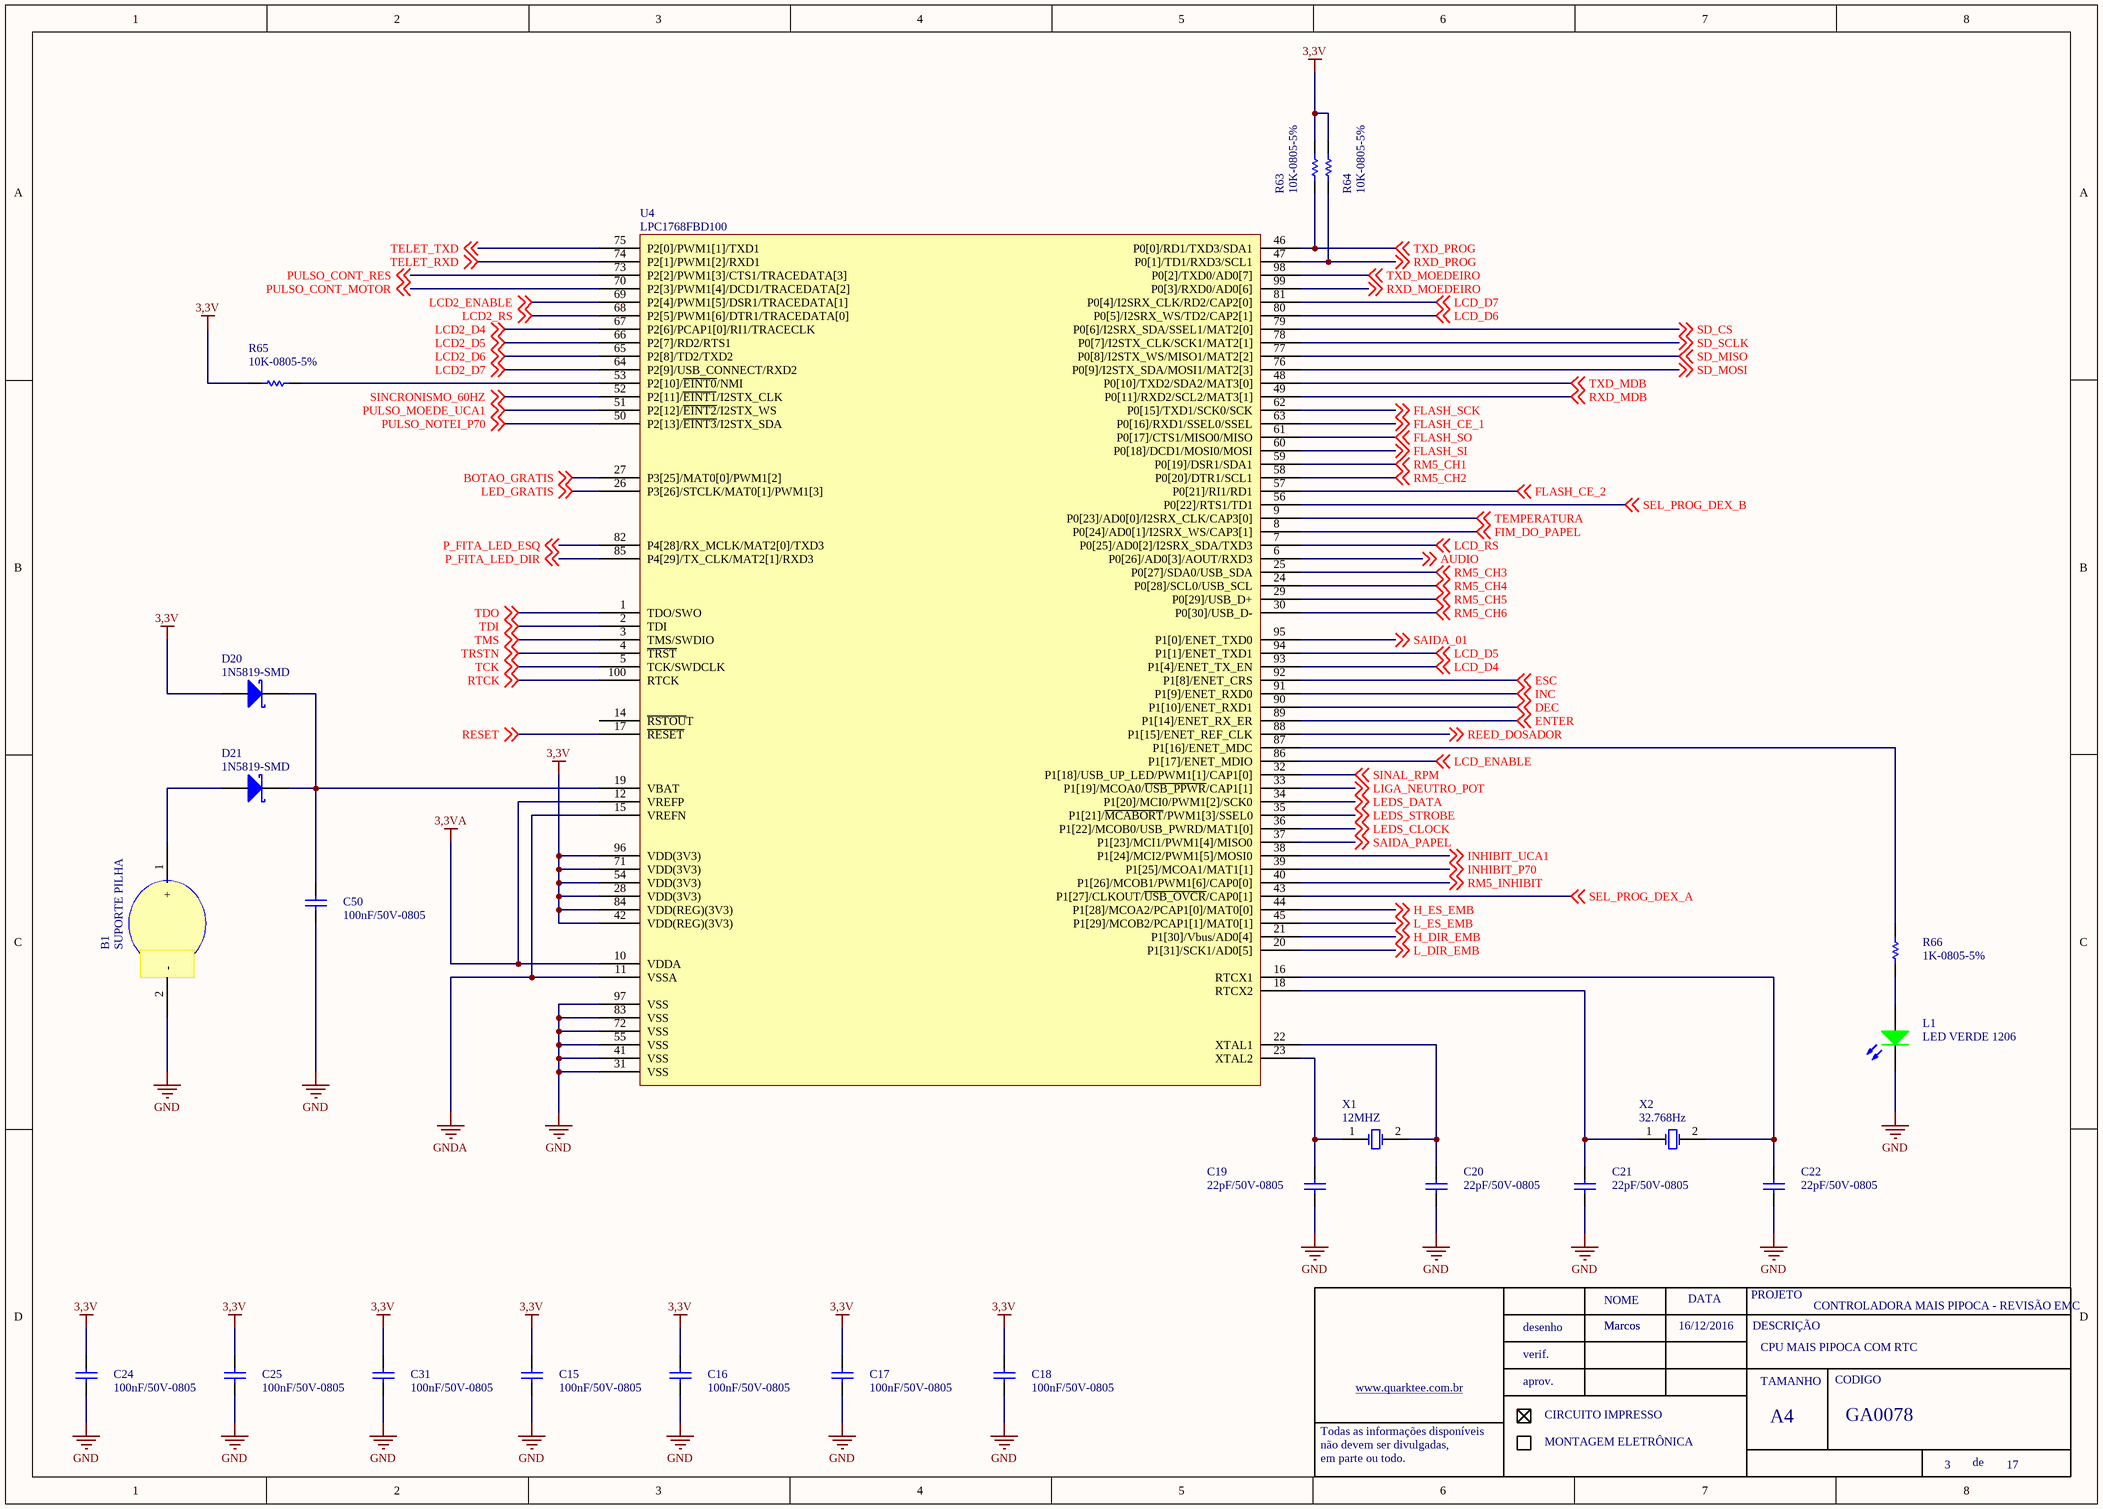
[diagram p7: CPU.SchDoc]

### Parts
B1  SUPORTE PILHA  [SUPORTE PILHA CR2032]
C15  100nF/50V-0805  [0805-REVISADO ONDA]
C16  100nF/50V-0805  [0805-REVISADO ONDA]
C17  100nF/50V-0805  [0805-REVISADO ONDA]
C18  100nF/50V-0805  [0805-REVISADO ONDA]
C19  22pF/50V-0805  [0805-REVISADO ONDA]
C20  22pF/50V-0805  [0805-REVISADO ONDA]
C21  22pF/50V-0805  [0805-REVISADO ONDA]
C22  22pF/50V-0805  [0805-REVISADO ONDA]
C24  100nF/50V-0805  [0805-REVISADO ONDA]
C25  100nF/50V-0805  [0805-REVISADO ONDA]
C31  100nF/50V-0805  [0805-REVISADO ONDA]
C50  100nF/50V-0805  [0805-REVISADO ONDA]
D20  1N5819-SMD
D21  1N5819-SMD
L1  LED VERDE 1206  [LED 1206]
R63  10K-0805-5%  [0805-REVISADO ONDA]
R64  10K-0805-5%  [0805-REVISADO ONDA]
R65  10K-0805-5%  [0805-REVISADO ONDA]
R66  1K-0805-5%  [0805-REVISADO ONDA]
U4  LPC1768FBD100  [LQFP-100 pasta]
X1  12MHZ  [HC49USM]
X2  32.768Hz  [CRISTAL TH3]

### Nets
3,3V: C15.2 C16.2 C17.2 C18.2 C24.2 C25.2 C31.2 D20.1(A) R63.2 R64.2 R65.1 U4.28(VDD(3V3)) U4.42(VDD(REG)(3V3)) U4.54(VDD(3V3)) U4.71(VDD(3V3)) U4.84(VDD(REG)(3V3)) U4.96(VDD(3V3))
3,3VA: U4.10(VDDA) U4.12(VREFP)
GND: B1.2(-) C15.1 C16.1 C17.1 C18.1 C19.1 C20.1 C21.1 C22.1 C24.1 C25.1 C31.1 C50.1 L1.2(K) U4.31(VSS) U4.41(VSS) U4.55(VSS) U4.72(VSS) U4.83(VSS) U4.97(VSS)
GNDA: U4.11(VSSA) U4.15(VREFN)
AUDIO: U4.6(P0[26]/AD0[3]/AOUT/RXD3) ; off-sheet AUDIO
BOTAO_GRATIS: U4.27(P3[25]/MAT0[0]/PWM1[2]) ; off-sheet BOTAO_GRATIS
DEC: U4.90(P1[10]/ENET_RXD1) ; off-sheet DEC
ENTER: U4.89(P1[14]/ENET_RX_ER) ; off-sheet ENTER
ESC: U4.92(P1[8]/ENET_CRS) ; off-sheet ESC
FIM_DO_PAPEL: U4.8(P0[24]/AD0[1]/I2SRX_WS/CAP3[1]) ; off-sheet FIM_DO_PAPEL
FLASH_CE_1: U4.63(P0[16]/RXD1/SSEL0/SSEL) ; off-sheet FLASH_CE_1
FLASH_CE_2: U4.57(P0[21]/RI1/RD1) ; off-sheet FLASH_CE_2
FLASH_SCK: U4.62(P0[15]/TXD1/SCK0/SCK) ; off-sheet FLASH_SCK
FLASH_SI: U4.60(P0[18]/DCD1/MOSI0/MOSI) ; off-sheet FLASH_SI
FLASH_SO: U4.61(P0[17]/CTS1/MISO0/MISO) ; off-sheet FLASH_SO
H_DIR_EMB: U4.21(P1[30]/Vbus/AD0[4]) ; off-sheet H_DIR_EMB
H_ES_EMB: U4.44(P1[28]/MCOA2/PCAP1[0]/MAT0[0]) ; off-sheet H_ES_EMB
INC: U4.91(P1[9]/ENET_RXD0) ; off-sheet INC
INHIBIT_P70: U4.39(P1[25]/MCOA1/MAT1[1]) ; off-sheet INHIBIT_P70
INHIBIT_UCA1: U4.38(P1[24]/MCI2/PWM1[5]/MOSI0) ; off-sheet INHIBIT_UCA1
L_DIR_EMB: U4.20(P1[31]/SCK1/AD0[5]) ; off-sheet L_DIR_EMB
L_ES_EMB: U4.45(P1[29]/MCOB2/PCAP1[1]/MAT0[1]) ; off-sheet L_ES_EMB
LCD2_D4: U4.67(P2[6]/PCAP1[0]/RI1/TRACECLK) ; off-sheet LCD2_D4
LCD2_D5: U4.66(P2[7]/RD2/RTS1) ; off-sheet LCD2_D5
LCD2_D6: U4.65(P2[8]/TD2/TXD2) ; off-sheet LCD2_D6
LCD2_D7: U4.64(P2[9]/USB_CONNECT/RXD2) ; off-sheet LCD2_D7
LCD2_ENABLE: U4.69(P2[4]/PWM1[5]/DSR1/TRACEDATA[1]) ; off-sheet LCD2_ENABLE
LCD2_RS: U4.68(P2[5]/PWM1[6]/DTR1/TRACEDATA[0]) ; off-sheet LCD2_RS
LCD_D4: U4.93(P1[4]/ENET_TX_EN) ; off-sheet LCD_D4
LCD_D5: U4.94(P1[1]/ENET_TXD1) ; off-sheet LCD_D5
LCD_D6: U4.80(P0[5]/I2SRX_WS/TD2/CAP2[1]) ; off-sheet LCD_D6
LCD_D7: U4.81(P0[4]/I2SRX_CLK/RD2/CAP2[0]) ; off-sheet LCD_D7
LCD_ENABLE: U4.86(P1[17]/ENET_MDIO) ; off-sheet LCD_ENABLE
LCD_RS: U4.7(P0[25]/AD0[2]/I2SRX_SDA/TXD3) ; off-sheet LCD_RS
LED_GRATIS: U4.26(P3[26]/STCLK/MAT0[1]/PWM1[3]) ; off-sheet LED_GRATIS
LEDS_CLOCK: U4.36(P1[22]/MCOB0/USB_PWRD/MAT1[0]) ; off-sheet LEDS_CLOCK
LEDS_DATA: U4.34(P1[20]/MCI0/PWM1[2]/SCK0) ; off-sheet LEDS_DATA
LEDS_STROBE: U4.35(P1[21]/~{MCABORT}/PWM1[3]/SSEL0) ; off-sheet LEDS_STROBE
LIGA_NEUTRO_POT: U4.33(P1[19]/MCOA0/~{USB_PPWR}/CAP1[1]) ; off-sheet LIGA_NEUTRO_POT
P_FITA_LED_DIR: U4.85(P4[29]/TX_CLK/MAT2[1]/RXD3) ; off-sheet P_FITA_LED_DIR
P_FITA_LED_ESQ: U4.82(P4[28]/RX_MCLK/MAT2[0]/TXD3) ; off-sheet P_FITA_LED_ESQ
PULSO_CONT_MOTOR: U4.70(P2[3]/PWM1[4]/DCD1/TRACEDATA[2]) ; off-sheet PULSO_CONT_MOTOR
PULSO_CONT_RES: U4.73(P2[2]/PWM1[3]/CTS1/TRACEDATA[3]) ; off-sheet PULSO_CONT_RES
PULSO_MOEDE_UCA1: U4.51(P2[12]/~{EINT2}/I2STX_WS) ; off-sheet PULSO_MOEDE_UCA1
PULSO_NOTEI_P70: U4.50(P2[13]/~{EINT3}/I2STX_SDA) ; off-sheet PULSO_NOTEI_P70
REED_DOSADOR: U4.88(P1[15]/ENET_REF_CLK) ; off-sheet REED_DOSADOR
RESET: U4.17(~{RESET}) ; off-sheet RESET
RM5_CH1: U4.59(P0[19]/DSR1/SDA1) ; off-sheet RM5_CH1
RM5_CH2: U4.58(P0[20]/DTR1/SCL1) ; off-sheet RM5_CH2
RM5_CH3: U4.25(P0[27]/SDA0/USB_SDA) ; off-sheet RM5_CH3
RM5_CH4: U4.24(P0[28]/SCL0/USB_SCL) ; off-sheet RM5_CH4
RM5_CH5: U4.29(P0[29]/USB_D+) ; off-sheet RM5_CH5
RM5_CH6: U4.30(P0[30]/USB_D-) ; off-sheet RM5_CH6
RM5_INHIBIT: U4.40(P1[26]/MCOB1/PWM1[6]/CAP0[0]) ; off-sheet RM5_INHIBIT
RTCK: U4.100(RTCK) ; off-sheet RTCK
RXD_MDB: U4.49(P0[11]/RXD2/SCL2/MAT3[1]) ; off-sheet RXD_MDB
RXD_MOEDEIRO: U4.99(P0[3]/RXD0/AD0[6]) ; off-sheet RXD_MOEDEIRO
RXD_PROG: R64.1 U4.47(P0[1]/TD1/RXD3/SCL1) ; off-sheet RXD_PROG
SAIDA_01: U4.95(P1[0]/ENET_TXD0) ; off-sheet SAIDA_01
SAIDA_PAPEL: U4.37(P1[23]/MCI1/PWM1[4]/MISO0) ; off-sheet SAIDA_PAPEL
SD_CS: U4.79(P0[6]/I2SRX_SDA/SSEL1/MAT2[0]) ; off-sheet SD_CS
SD_MISO: U4.77(P0[8]/I2STX_WS/MISO1/MAT2[2]) ; off-sheet SD_MISO
SD_MOSI: U4.76(P0[9]/I2STX_SDA/MOSI1/MAT2[3]) ; off-sheet SD_MOSI
SD_SCLK: U4.78(P0[7]/I2STX_CLK/SCK1/MAT2[1]) ; off-sheet SD_SCLK
SEL_PROG_DEX_A: U4.43(P1[27]/CLKOUT/~{USB_OVCR}/CAP0[1]) ; off-sheet SEL_PROG_DEX_A
SEL_PROG_DEX_B: U4.56(P0[22]/RTS1/TD1) ; off-sheet SEL_PROG_DEX_B
SINAL_RPM: U4.32(P1[18]/USB_UP_LED/PWM1[1]/CAP1[0]) ; off-sheet SINAL_RPM
SINCRONISMO_60HZ: U4.52(P2[11]/~{EINT1}/I2STX_CLK) ; off-sheet SINCRONISMO_60HZ
TCK: U4.5(TCK/SWDCLK) ; off-sheet TCK
TDI: U4.2(TDI) ; off-sheet TDI
TDO: U4.1(TDO/SWO) ; off-sheet TDO
TELET_RXD: U4.74(P2[1]/PWM1[2]/RXD1) ; off-sheet TELET_RXD
TELET_TXD: U4.75(P2[0]/PWM1[1]/TXD1) ; off-sheet TELET_TXD
TEMPERATURA: U4.9(P0[23]/AD0[0]/I2SRX_CLK/CAP3[0]) ; off-sheet TEMPERATURA
TMS: U4.3(TMS/SWDIO) ; off-sheet TMS
TRSTN: U4.4(~{TRST}) ; off-sheet TRSTN
TXD_MDB: U4.48(P0[10]/TXD2/SDA2/MAT3[0]) ; off-sheet TXD_MDB
TXD_MOEDEIRO: U4.98(P0[2]/TXD0/AD0[7]) ; off-sheet TXD_MOEDEIRO
TXD_PROG: R63.1 U4.46(P0[0]/RD1/TXD3/SDA1) ; off-sheet TXD_PROG
NetB1_1: B1.1(+) D21.1(A)
NetC19_2: C19.2 U4.23(XTAL2) X1.1(OSC1)
NetC20_2: C20.2 U4.22(XTAL1) X1.2(OSC2)
NetC21_2: C21.2 U4.18(RTCX2) X2.1(OSC1)
NetC22_2: C22.2 U4.16(RTCX1) X2.2(OSC2)
NetC50_2: C50.2 D20.2(K) D21.2(K) U4.19(VBAT)
NetL1_1: L1.1(A) R66.1
NetR65_2: R65.2 U4.53(P2[10]/~{EINT0}/NMI)
NetR66_2: R66.2 U4.87(P1[16]/ENET_MDC)

Not connected (* = marked no-connect by the designer): U4 14(~{RSTOU}T)

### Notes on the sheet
- Marcos
- 16/12/2016
- CPU MAIS PIPOCA COM RTC

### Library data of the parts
B1 = SUPORTE PILHA CR2032
C15-C18 C24 C25 C31 C50 = 100nF/50-0805-NPO
C19-C22 = 22pF-0805-NPO
D20 D21 = 1N5819
L1 = LED VERDE 0603 SMD: LED VERDE 0603 VERDE
U4 = LPC1768FDB100
X1 = CRISTAL 12MHZ
X2 = CRISTAL 32.768 Hz: CRISTAL 32.768Hz

## Sheet Entrada_comestero_rm5.SchDoc: CONTROLADORA MAIS PIPOCA - REVISÃO EMC
size A3; DocumentNumber: GA0078; SheetNumber: 12; SheetTotal: 17
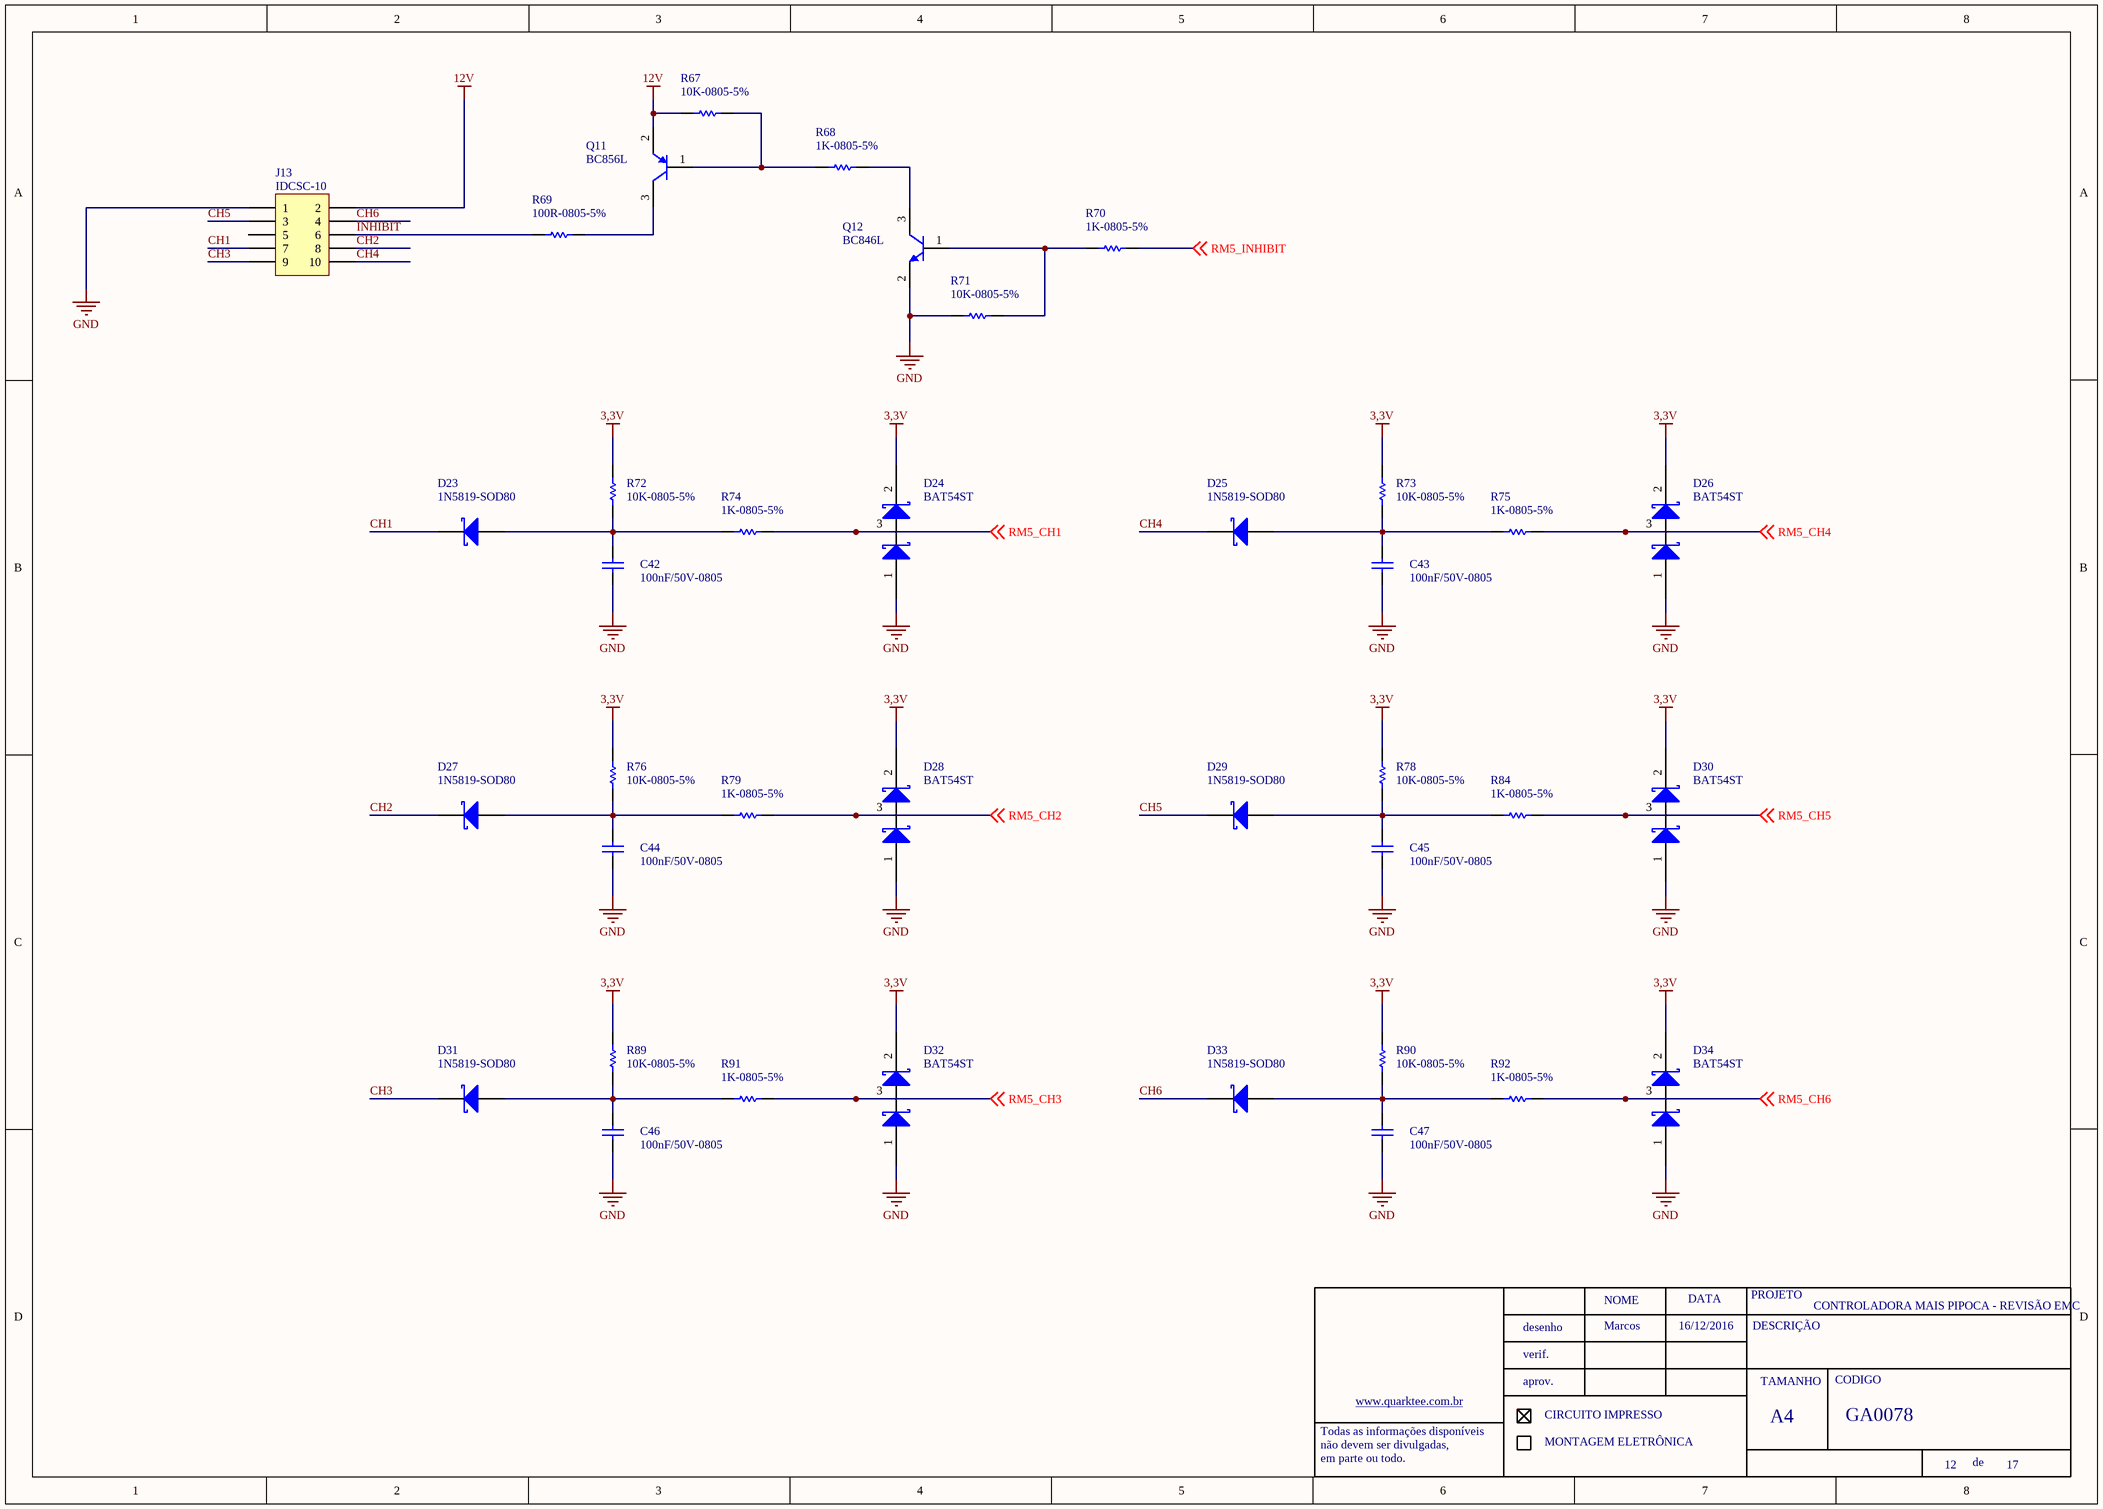
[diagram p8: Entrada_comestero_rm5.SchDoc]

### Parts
C42  100nF/50V-0805  [0805-REVISADO ONDA]
C43  100nF/50V-0805  [0805-REVISADO ONDA]
C44  100nF/50V-0805  [0805-REVISADO ONDA]
C45  100nF/50V-0805  [0805-REVISADO ONDA]
C46  100nF/50V-0805  [0805-REVISADO ONDA]
C47  100nF/50V-0805  [0805-REVISADO ONDA]
D23  1N5819-SOD80  [MINIMLEF/SOD80 - REVISADO ONDA]
D24  BAT54ST  [SOT23 - REVISADO ONDA]
D25  1N5819-SOD80  [MINIMLEF/SOD80 - REVISADO ONDA]
D26  BAT54ST  [SOT23 - REVISADO ONDA]
D27  1N5819-SOD80  [MINIMLEF/SOD80 - REVISADO ONDA]
D28  BAT54ST  [SOT23 - REVISADO ONDA]
D29  1N5819-SOD80  [MINIMLEF/SOD80 - REVISADO ONDA]
D30  BAT54ST  [SOT23 - REVISADO ONDA]
D31  1N5819-SOD80  [MINIMLEF/SOD80 - REVISADO ONDA]
D32  BAT54ST  [SOT23 - REVISADO ONDA]
D33  1N5819-SOD80  [MINIMLEF/SOD80 - REVISADO ONDA]
D34  BAT54ST  [SOT23 - REVISADO ONDA]
J13  IDCSC-10  [IDCSC-10]
Q11  BC856L  [SOT23 - REVISADO ONDA]
Q12  BC846L  [SOT23 - REVISADO ONDA]
R67  10K-0805-5%  [0805-REVISADO ONDA]
R68  1K-0805-5%  [0805-REVISADO ONDA]
R69  100R-0805-5%  [0805-REVISADO ONDA]
R70  1K-0805-5%  [0805-REVISADO ONDA]
R71  10K-0805-5%  [0805-REVISADO ONDA]
R72  10K-0805-5%  [0805-REVISADO ONDA]
R73  10K-0805-5%  [0805-REVISADO ONDA]
R74  1K-0805-5%  [0805-REVISADO ONDA]
R75  1K-0805-5%  [0805-REVISADO ONDA]
R76  10K-0805-5%  [0805-REVISADO ONDA]
R78  10K-0805-5%  [0805-REVISADO ONDA]
R79  1K-0805-5%  [0805-REVISADO ONDA]
R84  1K-0805-5%  [0805-REVISADO ONDA]
R89  10K-0805-5%  [0805-REVISADO ONDA]
R90  10K-0805-5%  [0805-REVISADO ONDA]
R91  1K-0805-5%  [0805-REVISADO ONDA]
R92  1K-0805-5%  [0805-REVISADO ONDA]

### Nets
3,3V: D24.2 D26.2 D28.2 D30.2 D32.2 D34.2 R72.2 R73.2 R76.2 R78.2 R89.2 R90.2
12V: J13.2 Q11.2(E) R67.1
GND: C42.1 C43.1 C44.1 C45.1 C46.1 C47.1 D24.1 D26.1 D28.1 D30.1 D32.1 D34.1 J13.1 Q12.2(E) R71.1
CH1: D23.2(K) J13.7
CH2: D27.2(K) J13.8
CH3: D31.2(K) J13.9
CH4: D25.2(K) J13.10
CH5: D29.2(K) J13.3
CH6: D33.2(K) J13.4
INHIBIT: J13.6 R69.1
RM5_CH1: D24.3 R74.2 ; off-sheet RM5_CH1
RM5_CH2: D28.3 R79.2 ; off-sheet RM5_CH2
RM5_CH3: D32.3 R91.2 ; off-sheet RM5_CH3
RM5_CH4: D26.3 R75.2 ; off-sheet RM5_CH4
RM5_CH5: D30.3 R84.2 ; off-sheet RM5_CH5
RM5_CH6: D34.3 R92.2 ; off-sheet RM5_CH6
RM5_INHIBIT: R70.2 ; off-sheet RM5_INHIBIT
NetC42_2: C42.2 D23.1(A) R72.1 R74.1
NetC43_2: C43.2 D25.1(A) R73.1 R75.1
NetC44_2: C44.2 D27.1(A) R76.1 R79.1
NetC45_2: C45.2 D29.1(A) R78.1 R84.1
NetC46_2: C46.2 D31.1(A) R89.1 R91.1
NetC47_2: C47.2 D33.1(A) R90.1 R92.1
NetQ11_1: Q11.1(B) R67.2 R68.1
NetQ11_3: Q11.3(C) R69.2
NetQ12_1: Q12.1(B) R70.1 R71.2
NetQ12_3: Q12.3(C) R68.2

Not connected (* = marked no-connect by the designer): J13 5

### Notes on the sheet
- Marcos
- 16/12/2016

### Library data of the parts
C42-C47 = 100nF/50-0805-NPO
D24 D26 D28 D30 D32 D34 = BA54
J13 = IDCSN: CONECTOR HEADER 10 VIAS 90º
Q12 = BC846
R70 = 100R-0805-5%

## Sheet IHM.SchDoc: CONTROLADORA MAIS PIPOCA - REVISÃO EMC
size A3; DocumentNumber: GA0078; SheetNumber: 9; SheetTotal: 17
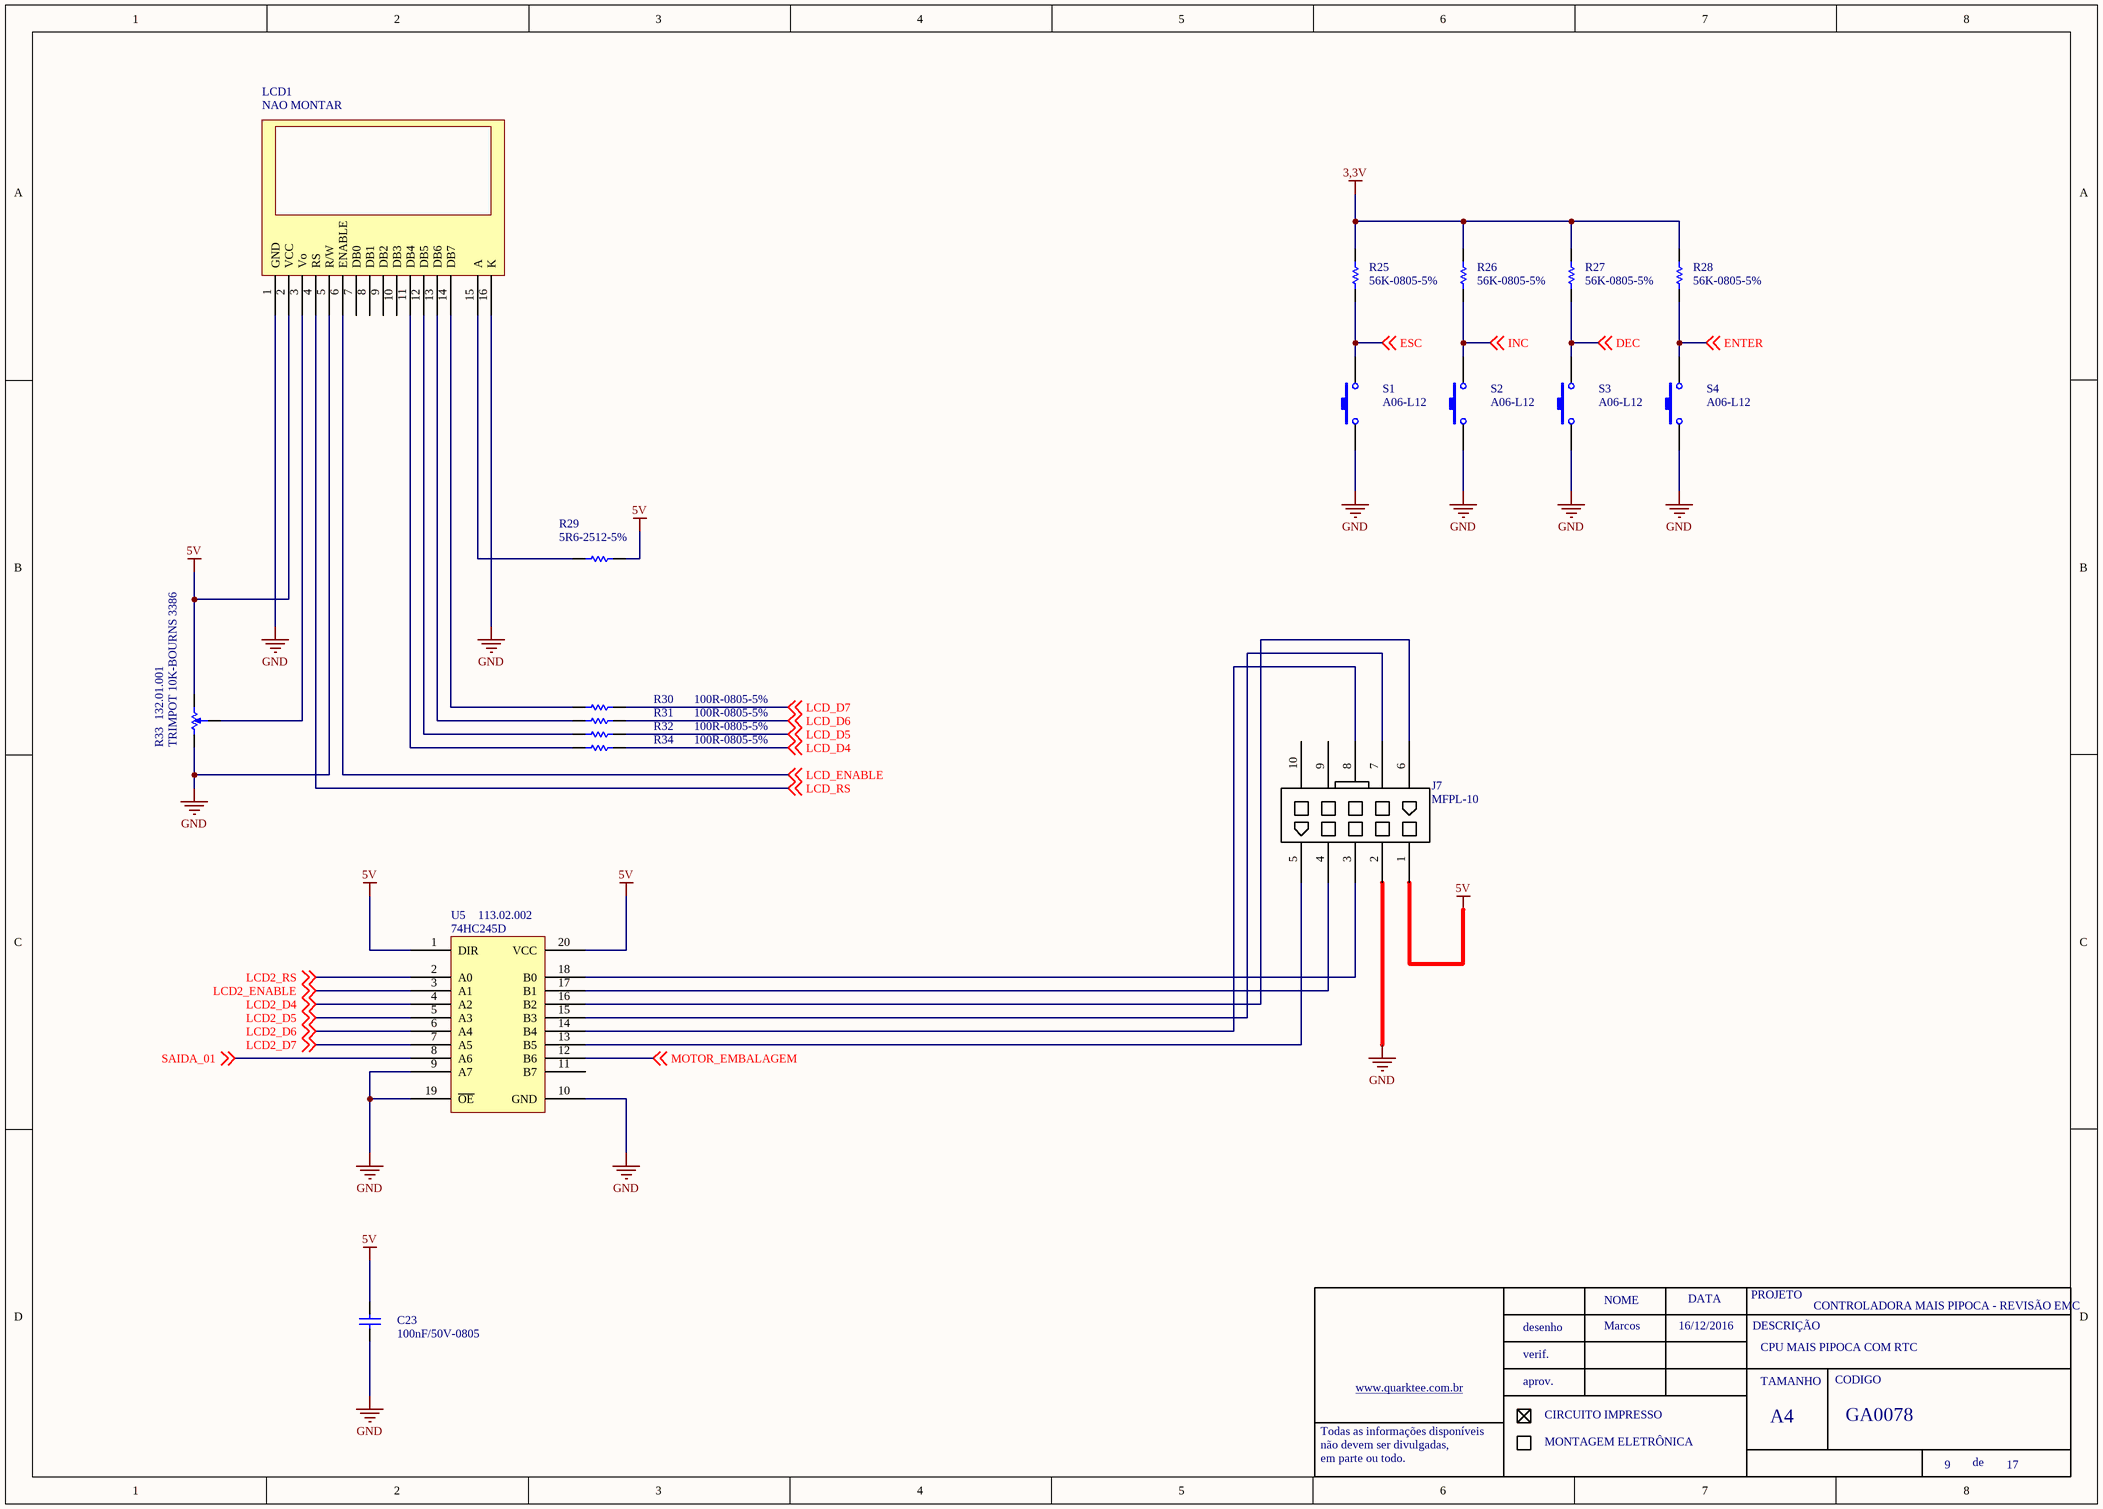
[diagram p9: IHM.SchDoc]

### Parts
C23  100nF/50V-0805  [0805-REVISADO ONDA]
J7  MFPL-10
LCD1  NAO MONTAR  [WH1602B_DS]
R25  56K-0805-5%  [0805-REVISADO ONDA]
R26  56K-0805-5%  [0805-REVISADO ONDA]
R27  56K-0805-5%  [0805-REVISADO ONDA]
R28  56K-0805-5%  [0805-REVISADO ONDA]
R29  5R6-2512-5%  [2512 - REVISADO ONDA]
R30  100R-0805-5%  [0805-REVISADO ONDA]
R31  100R-0805-5%  [0805-REVISADO ONDA]
R32  100R-0805-5%  [0805-REVISADO ONDA]
R33  TRIMPOT 10K-BOURNS 3386  ERP: 132.01.001  [TRIMPOT 3386]
R34  100R-0805-5%  [0805-REVISADO ONDA]
S1  A06-L12  [CHAVE_A06]
S2  A06-L12  [CHAVE_A06]
S3  A06-L12  [CHAVE_A06]
S4  A06-L12  [CHAVE_A06]
U5  74HC245D  ERP: 113.02.002  [SOIC-20]

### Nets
3,3V: R25.1 R26.1 R27.1 R28.1
5V: C23.2 J7.1 LCD1.2(VCC) R29.1 R33.1 U5.1(DIR) U5.20(VCC)
GND: C23.1 J7.2 LCD1.1(GND) LCD1.5(R/W) LCD1.16(K) R33.3 S1.1 S2.1 S3.1 S4.1 U5.9(A7) U5.10(GND) U5.19(~{OE})
DEC: R27.2 S3.2 ; off-sheet DEC
ENTER: R28.2 S4.2 ; off-sheet ENTER
ESC: R25.2 S1.2 ; off-sheet ESC
INC: R26.2 S2.2 ; off-sheet INC
LCD2_D4: U5.4(A2) ; off-sheet LCD2_D4
LCD2_D5: U5.5(A3) ; off-sheet LCD2_D5
LCD2_D6: U5.6(A4) ; off-sheet LCD2_D6
LCD2_D7: U5.7(A5) ; off-sheet LCD2_D7
LCD2_ENABLE: U5.3(A1) ; off-sheet LCD2_ENABLE
LCD2_RS: U5.2(A0) ; off-sheet LCD2_RS
LCD_D4: R34.2 ; off-sheet LCD_D4
LCD_D5: R32.2 ; off-sheet LCD_D5
LCD_D6: R31.2 ; off-sheet LCD_D6
LCD_D7: R30.2 ; off-sheet LCD_D7
LCD_ENABLE: LCD1.6(ENABLE) ; off-sheet LCD_ENABLE
LCD_RS: LCD1.4(RS) ; off-sheet LCD_RS
MOTOR_EMBALAGEM: U5.12(B6) ; off-sheet MOTOR_EMBALAGEM
SAIDA_01: U5.8(A6) ; off-sheet SAIDA_01
NetJ7_3: J7.3 U5.18(B0)
NetJ7_4: J7.4 U5.17(B1)
NetJ7_5: J7.5 U5.13(B5)
NetJ7_6: J7.6 U5.16(B2)
NetJ7_7: J7.7 U5.15(B3)
NetJ7_8: J7.8 U5.14(B4)
NetLCD1_3: LCD1.3(Vo) R33.2
NetLCD1_11: LCD1.11(DB4) R34.1
NetLCD1_12: LCD1.12(DB5) R32.1
NetLCD1_13: LCD1.13(DB6) R31.1
NetLCD1_14: LCD1.14(DB7) R30.1
NetLCD1_15: LCD1.15(A) R29.2

Not connected (* = marked no-connect by the designer): J7 9 10; LCD1 7(DB0) 8(DB1) 9(DB2) 10(DB3); U5 11(B7)

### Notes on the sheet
- Marcos
- 16/12/2016
- CPU MAIS PIPOCA COM RTC

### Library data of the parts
C23 = 100nF/50-0805-NPO
LCD1 = WH1602A
R29 = RES 5R6-CR100: 5R6-CR100
R33 = TRIMPOT 3386 50K

## Sheet Interface_gratis.SchDoc: CONTROLADORA MAIS PIPOCA - REVISÃO EMC
size A3; DocumentNumber: GA0078; SheetNumber: 17; SheetTotal: 17
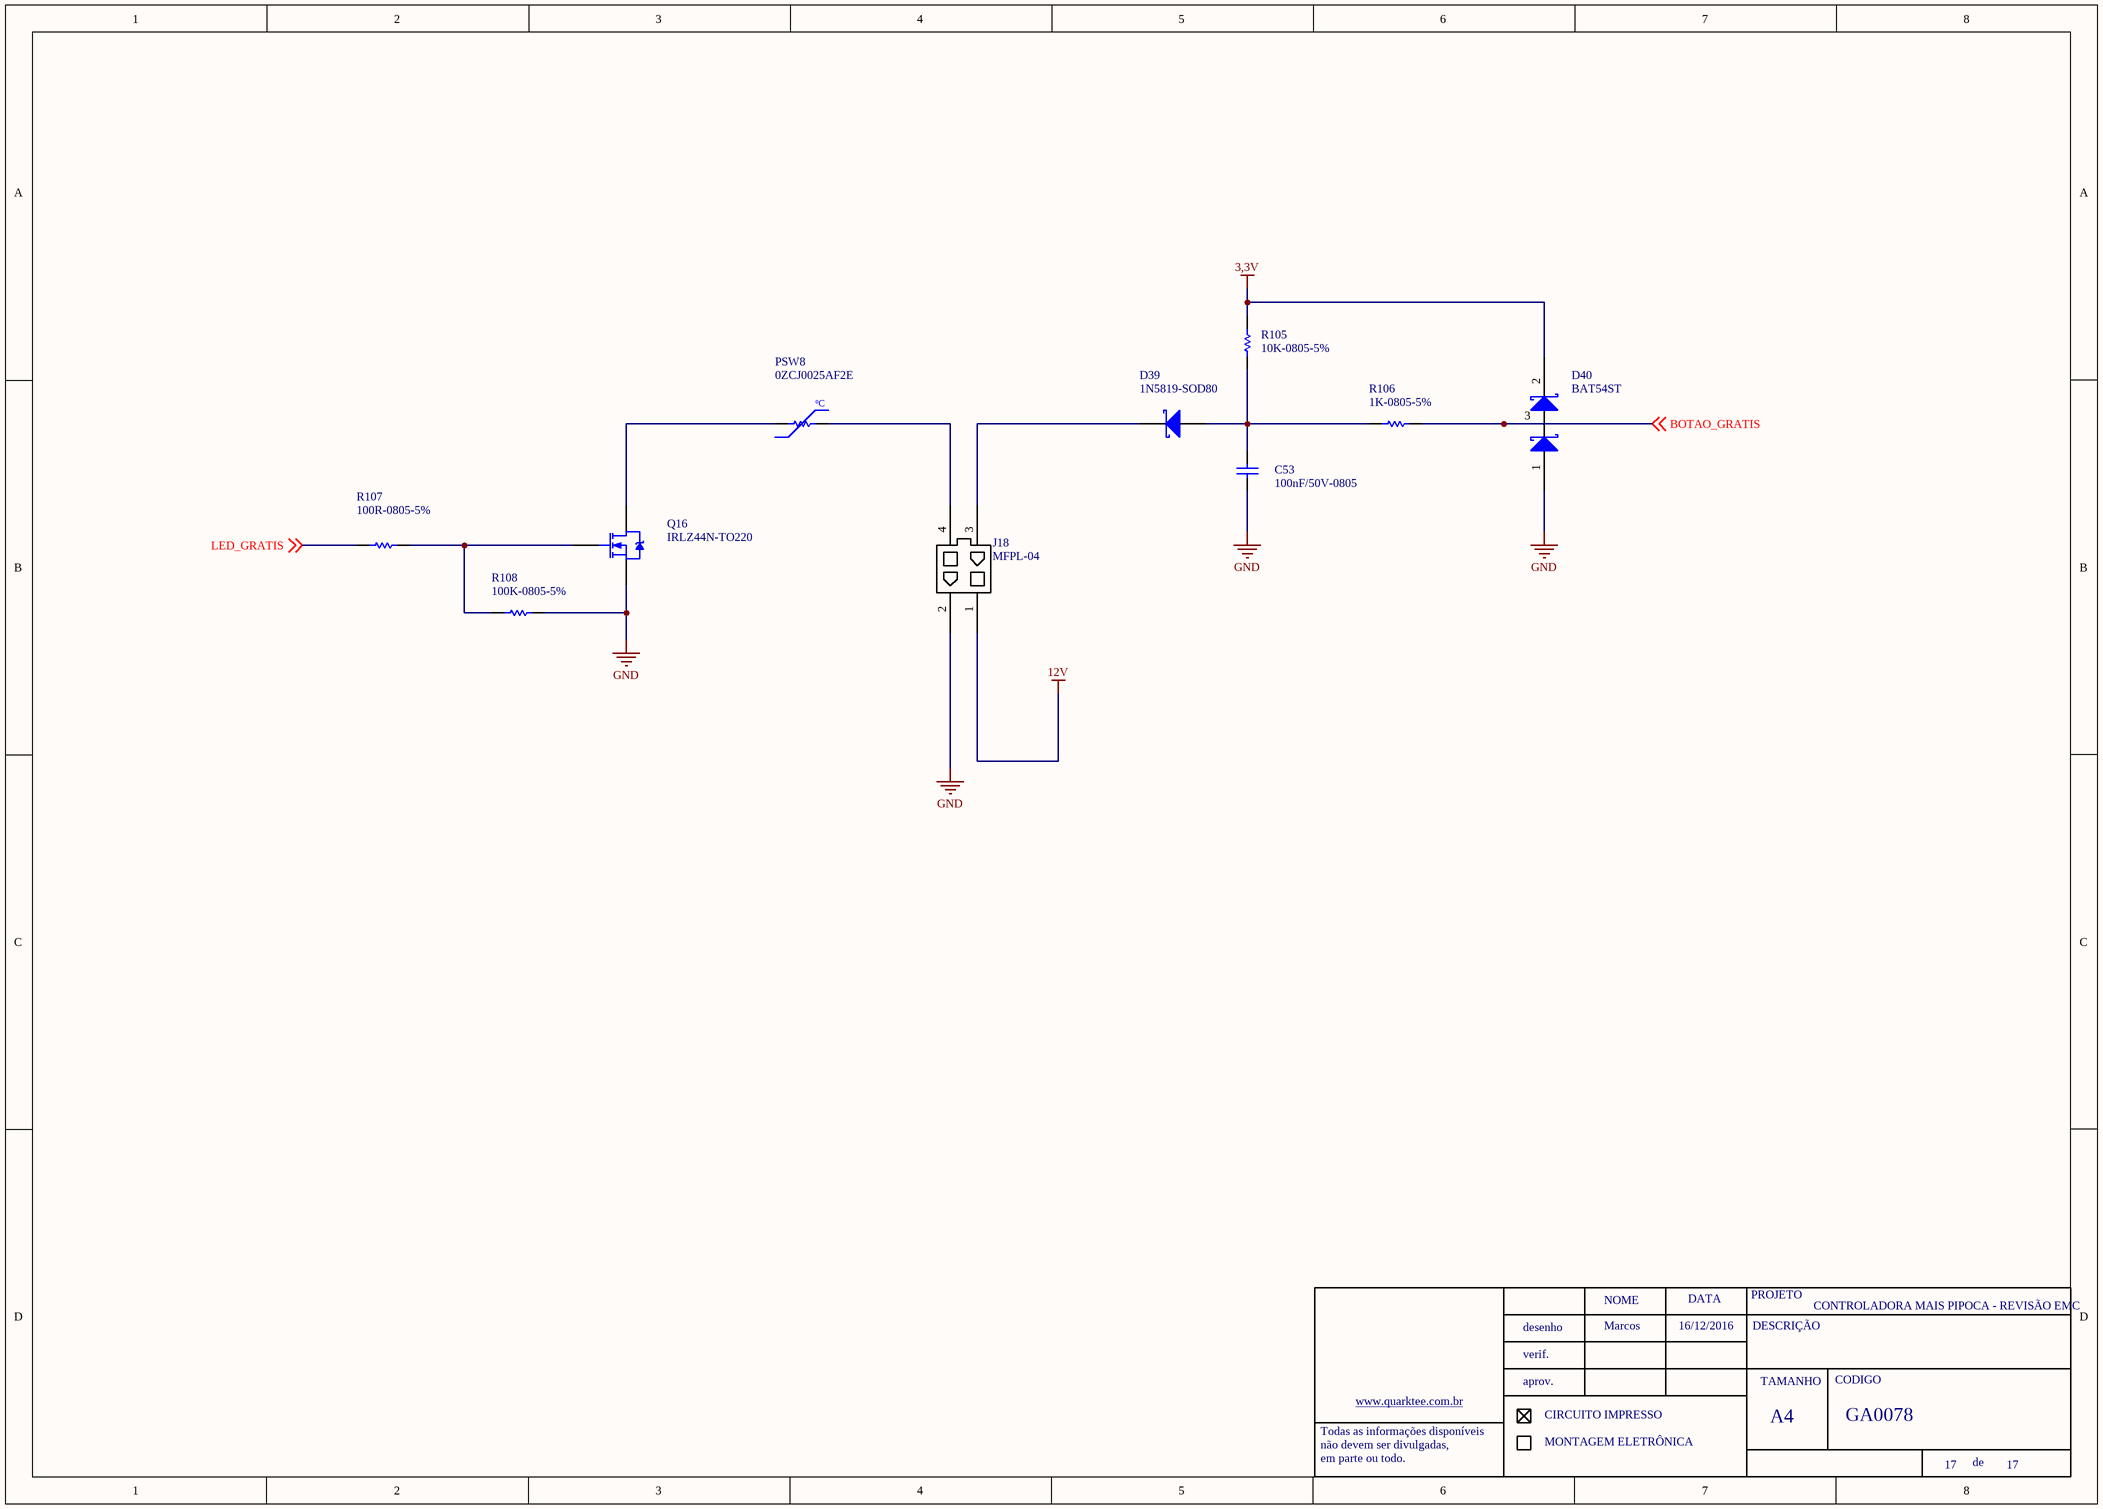
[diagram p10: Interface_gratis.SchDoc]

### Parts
C53  100nF/50V-0805  [0805-REVISADO ONDA]
D39  1N5819-SOD80  [MINIMLEF/SOD80 - REVISADO ONDA]
D40  BAT54ST  [SOT23 - REVISADO ONDA]
J18  MFPL-04
PSW8  0ZCJ0025AF2E  [1206-REVISADO ONDA]
Q16  IRLZ44N-TO220  [TO220-3 EM PÉ]
R105  10K-0805-5%  [0805-REVISADO ONDA]
R106  1K-0805-5%  [0805-REVISADO ONDA]
R107  100R-0805-5%  [0805-REVISADO ONDA]
R108  100K-0805-5%  [0805-REVISADO ONDA]

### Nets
3,3V: D40.2 R105.2
12V: J18.1
GND: C53.1 D40.1 J18.2 Q16.3(S) R108.2
BOTAO_GRATIS: D40.3 R106.2 ; off-sheet BOTAO_GRATIS
LED_GRATIS: R107.1 ; off-sheet LED_GRATIS
NetC53_2: C53.2 D39.1(A) R105.1 R106.1
NetD39_2: D39.2(K) J18.3
NetJ18_4: J18.4 PSW8.2
NetPSW8_1: PSW8.1 Q16.2(D)
NetQ16_1: Q16.1(G) R107.2 R108.1

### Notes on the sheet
- Marcos
- 16/12/2016

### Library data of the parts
C53 = 100nF/50-0805-NPO
PSW8 = PTC 2A-120V

## Sheet InterfaceConfiguracao.SchDoc: CONTROLADORA MAIS PIPOCA - REVISÃO EMC
size A3; DocumentNumber: GA0078; SheetNumber: 10; SheetTotal: 17
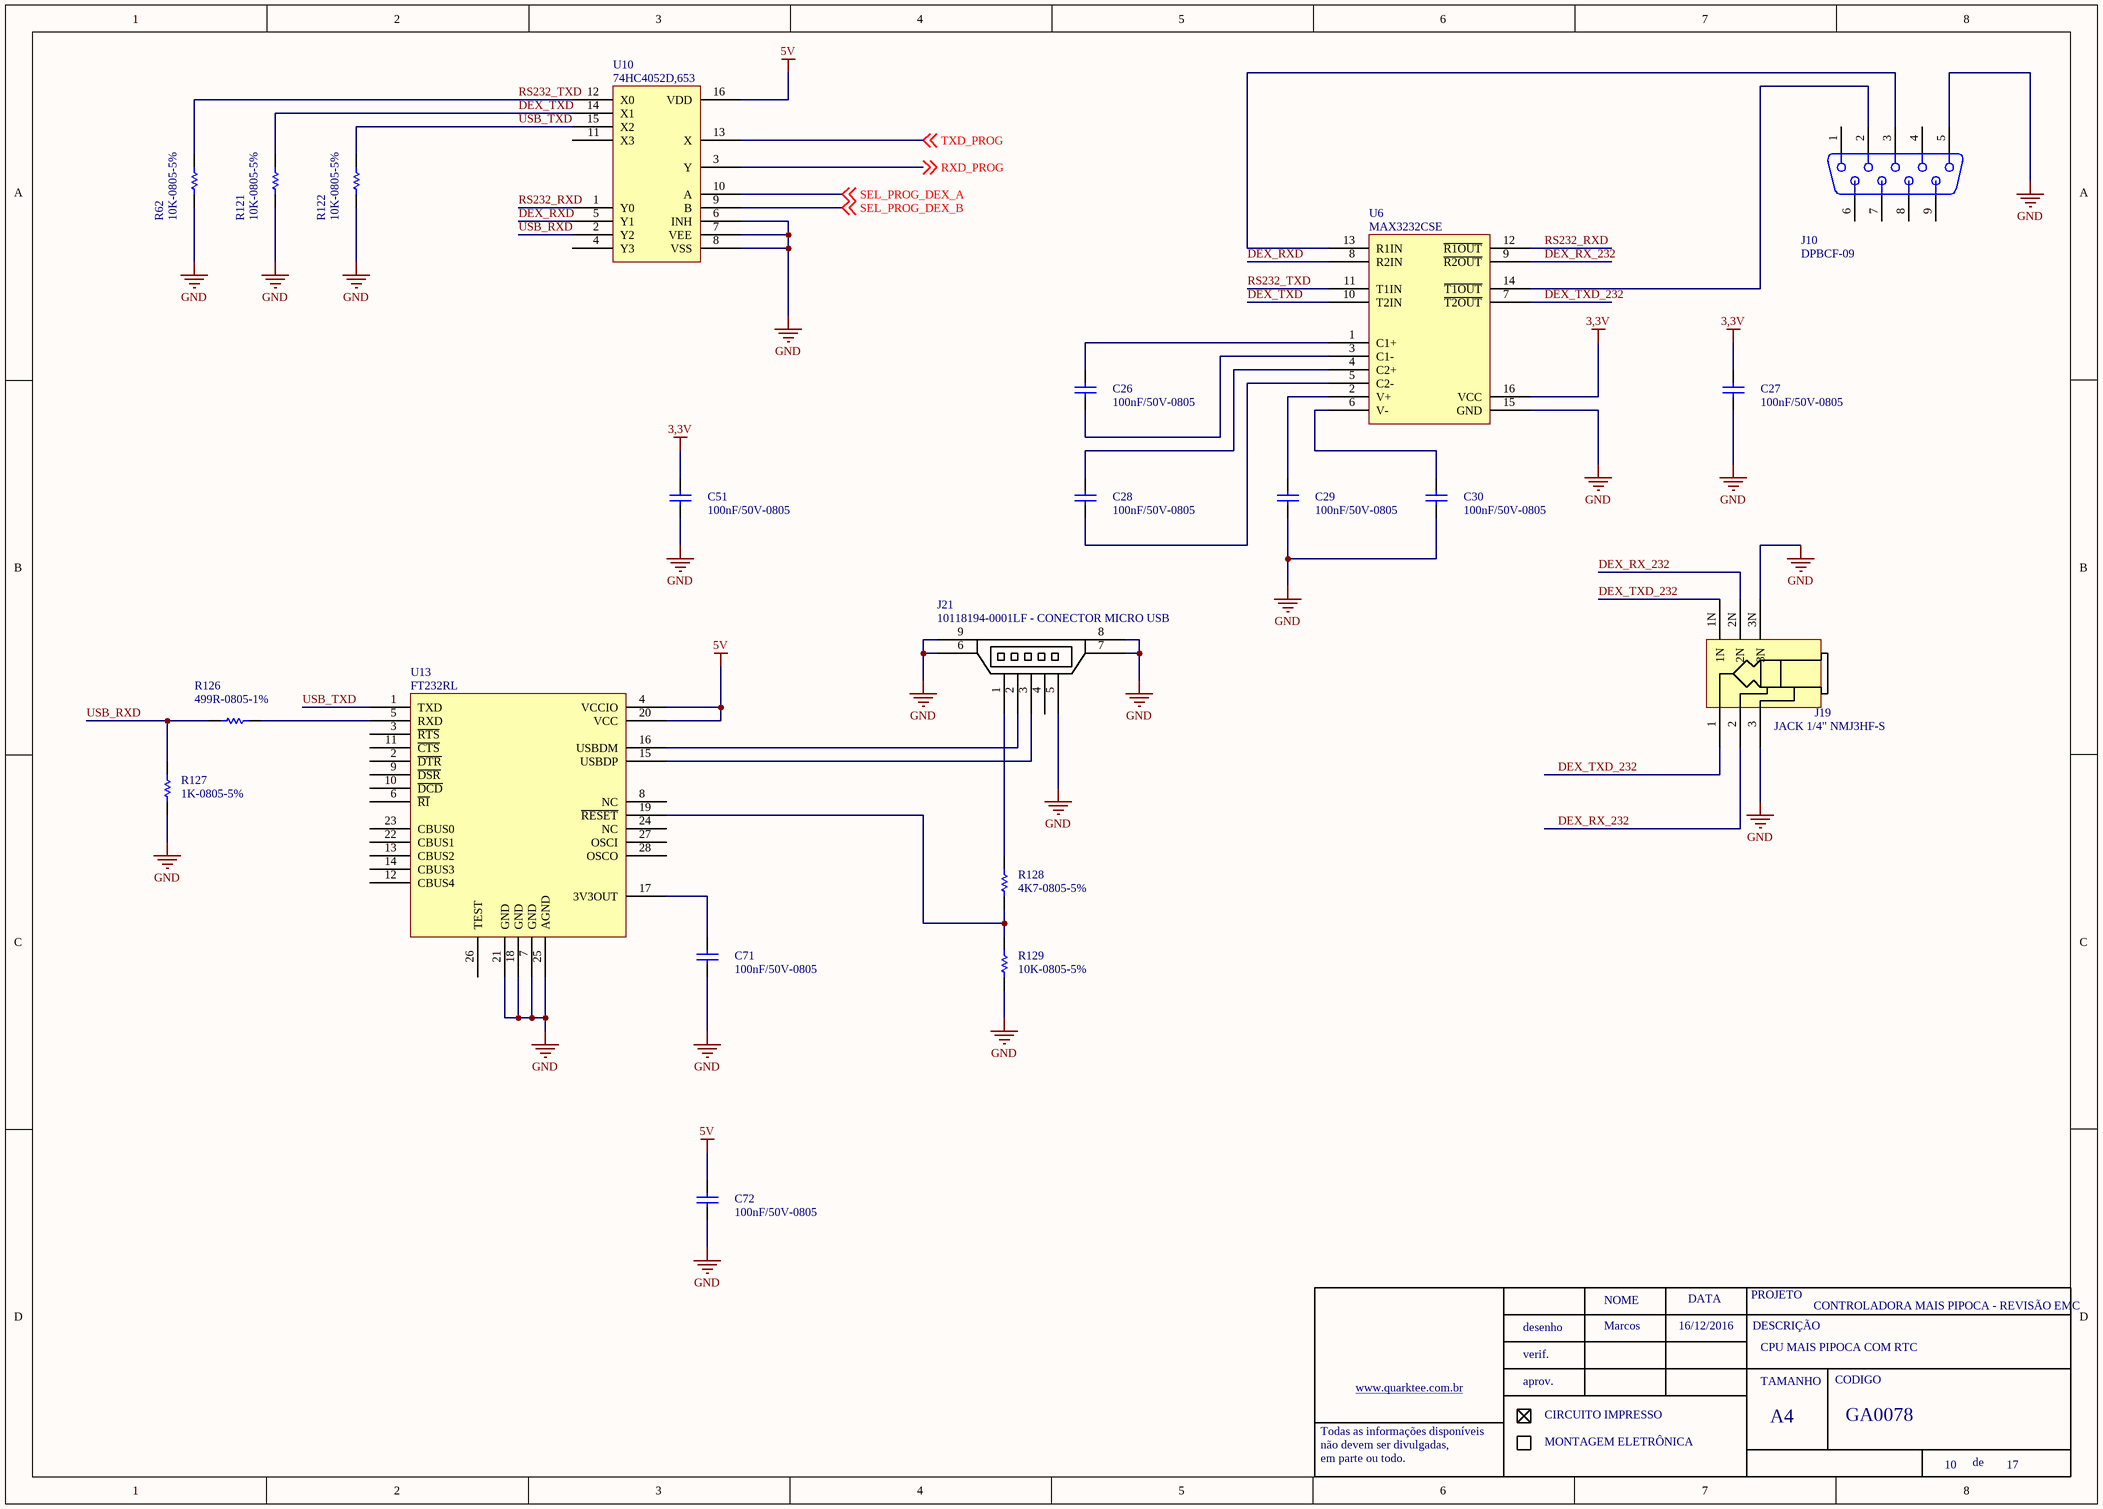
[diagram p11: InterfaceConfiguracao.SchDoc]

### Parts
C26  100nF/50V-0805  [0805-REVISADO ONDA]
C27  100nF/50V-0805  [0805-REVISADO ONDA]
C28  100nF/50V-0805  [0805-REVISADO ONDA]
C29  100nF/50V-0805  [0805-REVISADO ONDA]
C30  100nF/50V-0805  [0805-REVISADO ONDA]
C51  100nF/50V-0805  [0805-REVISADO ONDA]
C71  100nF/50V-0805  [0805-REVISADO ONDA]
C72  100nF/50V-0805  [0805-REVISADO ONDA]
J10  DPBCF-09  [DB9-FÊMEA MONTAGEM EM PCI 180]
J19  JACK 1/4" NMJ3HF-S
J21  10118194-0001LF - CONECTOR MICRO USB
R62  10K-0805-5%  [0805-REVISADO ONDA]
R121  10K-0805-5%  [0805-REVISADO ONDA]
R122  10K-0805-5%  [0805-REVISADO ONDA]
R126  499R-0805-1%  [0805-REVISADO ONDA]
R127  1K-0805-5%  [0805-REVISADO ONDA]
R128  4K7-0805-5%  [0805-REVISADO ONDA]
R129  10K-0805-5%  [0805-REVISADO ONDA]
U6  MAX3232CSE  [SOIC 16 PINOS]
U10  74HC4052D,653
U13  FT232RL

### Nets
3,3V: C27.2 C51.2 U6.16(VCC)
5V: C72.2 U10.16(VDD) U13.4(VCCIO) U13.20(VCC)
GND: C27.1 C29.1 C30.1 C51.1 C71.1 C72.1 J10.5 J19.3 J19.3N J21.5 J21.6 J21.7 J21.8 J21.9 R62.1 R121.1 R122.1 R127.1 R129.1 U6.15(GND) U10.6(INH) U10.7(VEE) U10.8(VSS) U13.7(GND) U13.18(GND) U13.21(GND) U13.25(AGND)
DEX_RX_232: J19.2 J19.2N U6.9(~{R2OUT})
DEX_RXD: U6.8(R2IN) U10.5(Y1)
DEX_TXD: R121.2 U6.10(T2IN) U10.14(X1)
DEX_TXD_232: J19.1 J19.1N U6.7(~{T2OUT})
RS232_RXD: U6.12(~{R1OUT}) U10.1(Y0)
RS232_TXD: R62.2 U6.11(T1IN) U10.12(X0)
RXD_PROG: U10.3(Y) ; off-sheet RXD_PROG
SEL_PROG_DEX_A: U10.10(A) ; off-sheet SEL_PROG_DEX_A
SEL_PROG_DEX_B: U10.9(B) ; off-sheet SEL_PROG_DEX_B
TXD_PROG: U10.13(X) ; off-sheet TXD_PROG
USB_RXD: R126.1 R127.2 U10.2(Y2)
USB_TXD: R122.2 U10.15(X2) U13.1(TXD)
NetC26_1: C26.1 U6.3(C1-)
NetC26_2: C26.2 U6.1(C1+)
NetC28_1: C28.1 U6.5(C2-)
NetC28_2: C28.2 U6.4(C2+)
NetC29_2: C29.2 U6.2(V+)
NetC30_2: C30.2 U6.6(V-)
NetC71_2: C71.2 U13.17(3V3OUT)
NetJ10_2: J10.2 U6.14(~{T1OUT})
NetJ10_3: J10.3 U6.13(R1IN)
NetJ21_1: J21.1 R128.2
NetJ21_2: J21.2 U13.16(USBDM)
NetJ21_3: J21.3 U13.15(USBDP)
NetR126_2: R126.2 U13.5(RXD)
NetR128_1: R128.1 R129.2 U13.19(~{RESET})

Not connected (* = marked no-connect by the designer): J10 1 4 6 7 8 9; J21 4; U10 4(Y3) 11(X3); U13 2(~{DTR}) 3(~{RTS}) 6(~{RI}) 8(NC) 9(~{DSR}) 10(~{DCD}) 11(~{CTS}) 12(CBUS4) 13(CBUS2) 14(CBUS3) 22(CBUS1) 23(CBUS0) 24(NC) 26(TEST) 27(OSCI) 28(OSCO)

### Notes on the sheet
- Marcos
- 16/12/2016
- CPU MAIS PIPOCA COM RTC

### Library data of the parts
C26-C30 C51 C71 C72 = 100nF/50-0805-NPO
J10 = DB-9 - FÊMEA 180º MONTAGEM EM PCI: DBPCF-09
J19 = NMJ3HF-S
J21 = MINI_USB
R126 = 1K-0805-5%
R128 = 10K-0805-5%
U10 = CD74HC4052PWR

## Sheet JTAG.SchDoc: CONTROLADORA MAIS PIPOCA - REVISÃO EMC
size A3; DocumentNumber: GA0078; SheetNumber: 13; SheetTotal: 17
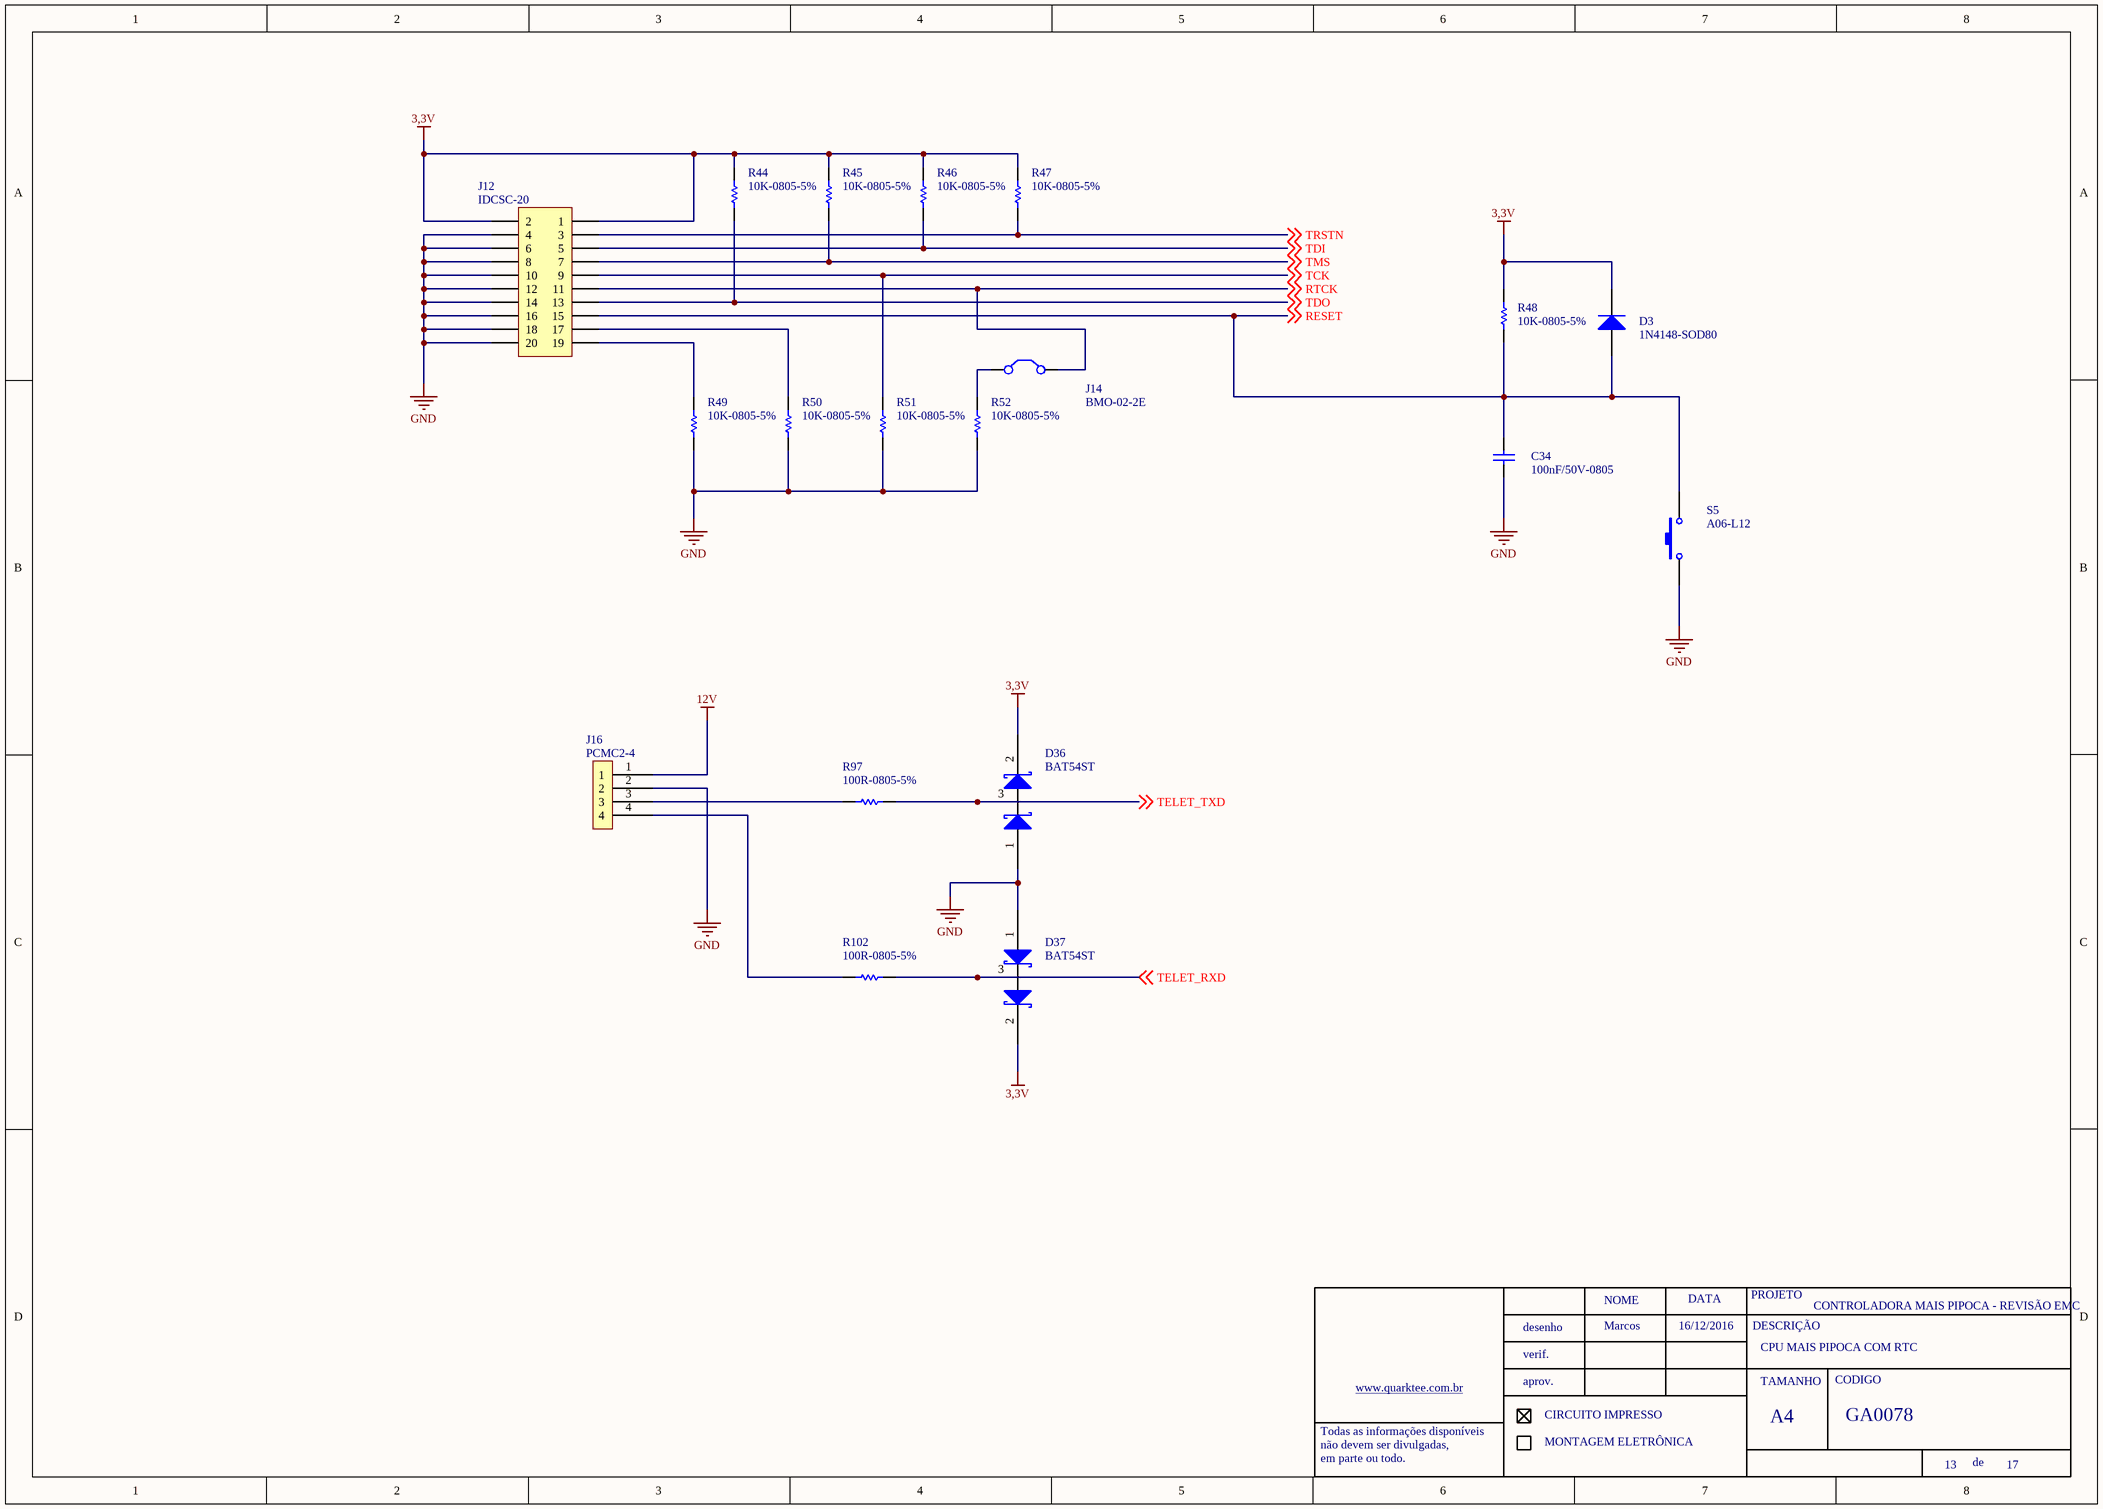
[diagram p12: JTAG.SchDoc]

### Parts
C34  100nF/50V-0805  [0805-REVISADO ONDA]
D3  1N4148-SOD80  [MINIMLEF/SOD80 - REVISADO ONDA]
D36  BAT54ST  [SOT23 - REVISADO ONDA]
D37  BAT54ST  [SOT23 - REVISADO ONDA]
J12  IDCSC-20  [IDCSC-20]
J14  BMO-02-2E  [JUMPER100]
J16  PCMC2-4  [PHMC4-04]
R44  10K-0805-5%  [0805-REVISADO ONDA]
R45  10K-0805-5%  [0805-REVISADO ONDA]
R46  10K-0805-5%  [0805-REVISADO ONDA]
R47  10K-0805-5%  [0805-REVISADO ONDA]
R48  10K-0805-5%  [0805-REVISADO ONDA]
R49  10K-0805-5%  [0805-REVISADO ONDA]
R50  10K-0805-5%  [0805-REVISADO ONDA]
R51  10K-0805-5%  [0805-REVISADO ONDA]
R52  10K-0805-5%  [0805-REVISADO ONDA]
R97  100R-0805-5%  [0805-REVISADO ONDA]
R102  100R-0805-5%  [0805-REVISADO ONDA]
S5  A06-L12  [CHAVE_A06]

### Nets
3,3V: D3.2 D36.2 D37.2 J12.1 J12.2 R44.1 R45.1 R46.1 R47.1 R48.2
12V: J16.1
GND: C34.1 D36.1 D37.1 J12.4 J12.6 J12.8 J12.10 J12.12 J12.14 J12.16 J12.18 J12.20 J16.2 R49.2 R50.2 R51.2 R52.2 S5.1
RESET: C34.2 D3.1 J12.15 R48.1 S5.2 ; off-sheet RESET
RTCK: J12.11 J14.2(C2) ; off-sheet RTCK
TCK: J12.9 R51.1 ; off-sheet TCK
TDI: J12.5 R46.2 ; off-sheet TDI
TDO: J12.13 R44.2 ; off-sheet TDO
TELET_RXD: D37.3 R102.2 ; off-sheet TELET_RXD
TELET_TXD: D36.3 R97.2 ; off-sheet TELET_TXD
TMS: J12.7 R45.2 ; off-sheet TMS
TRSTN: J12.3 R47.2 ; off-sheet TRSTN
NetJ12_17: J12.17 R50.1
NetJ12_19: J12.19 R49.1
NetJ14_1: J14.1(C1) R52.1
NetJ16_3: J16.3 R97.1
NetJ16_4: J16.4 R102.1

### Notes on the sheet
- Marcos
- 16/12/2016
- CPU MAIS PIPOCA COM RTC

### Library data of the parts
C34 = 100nF/50-0805-NPO
J12 = HEADER 10x2: BARRA DE PINOS 10x2 VIAS; ERP: 10 x 434.00.060
J14 = BARRA DE PINOS
R44-R47 R49-R52 = RES 10K-0805

## Sheet Meios_pagamento.SchDoc: CONTROLADORA MAIS PIPOCA - REVISÃO EMC
size A3; DocumentNumber: GA0078; SheetNumber: 11; SheetTotal: 17
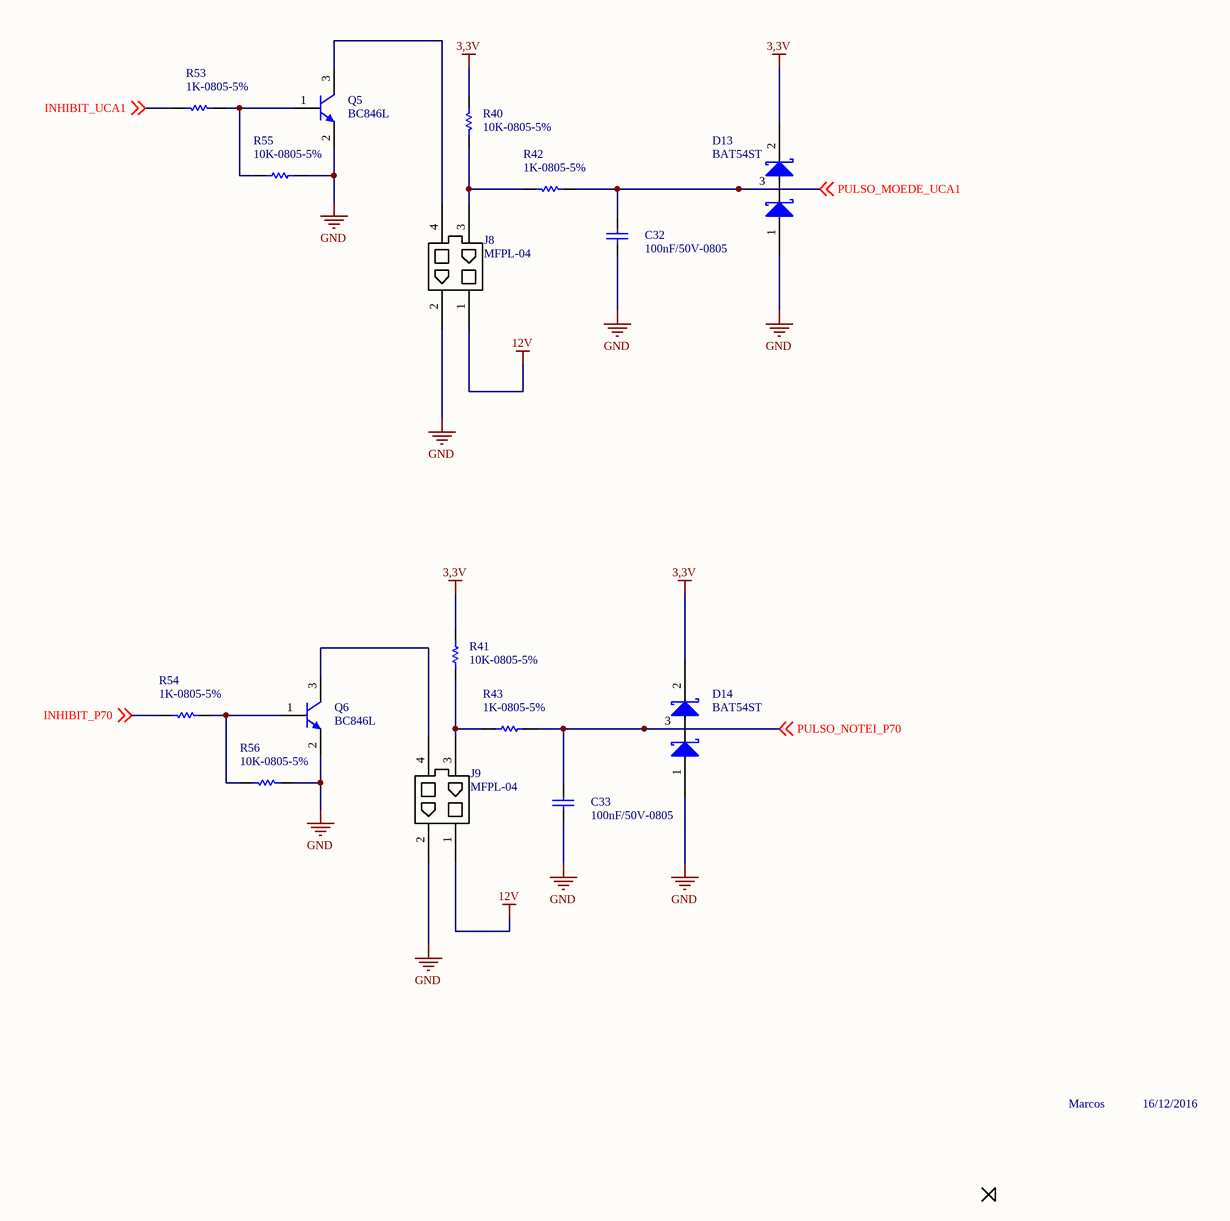
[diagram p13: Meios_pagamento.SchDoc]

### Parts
C32  100nF/50V-0805  [0805-REVISADO ONDA]
C33  100nF/50V-0805  [0805-REVISADO ONDA]
D13  BAT54ST  [SOT23 - REVISADO ONDA]
D14  BAT54ST  [SOT23 - REVISADO ONDA]
J8  MFPL-04
J9  MFPL-04
Q5  BC846L  [SOT23 - REVISADO ONDA]
Q6  BC846L  [SOT23 - REVISADO ONDA]
R40  10K-0805-5%  [0805-REVISADO ONDA]
R41  10K-0805-5%  [0805-REVISADO ONDA]
R42  1K-0805-5%  [0805-REVISADO ONDA]
R43  1K-0805-5%  [0805-REVISADO ONDA]
R53  1K-0805-5%  [0805-REVISADO ONDA]
R54  1K-0805-5%  [0805-REVISADO ONDA]
R55  10K-0805-5%  [0805-REVISADO ONDA]
R56  10K-0805-5%  [0805-REVISADO ONDA]

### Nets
3,3V: D13.2 D14.2 R40.2 R41.2
12V: J8.1 J9.1
GND: C32.1 C33.1 D13.1 D14.1 J8.2 J9.2 Q5.2(E) Q6.2(E) R55.2 R56.1
INHIBIT_P70: R54.2 ; off-sheet INHIBIT_P70
INHIBIT_UCA1: R53.2 ; off-sheet INHIBIT_UCA1
PULSO_MOEDE_UCA1: C32.2 D13.3 R42.1 ; off-sheet PULSO_MOEDE_UCA1
PULSO_NOTEI_P70: C33.2 D14.3 R43.2 ; off-sheet PULSO_NOTEI_P70
NetJ8_3: J8.3 R40.1 R42.2
NetJ8_4: J8.4 Q5.3(C)
NetJ9_3: J9.3 R41.1 R43.1
NetJ9_4: J9.4 Q6.3(C)
NetQ5_1: Q5.1(B) R53.1 R55.1
NetQ6_1: Q6.1(B) R54.1 R56.2

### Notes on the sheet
- Marcos
- 16/12/2016

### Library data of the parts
C32 C33 = 100nF/50-0805-NPO
Q5 Q6 = BC846

## Sheet Memoria.SchDoc: CONTROLADORA MAIS PIPOCA - REVISÃO EMC
size A3; DocumentNumber: GA0078; SheetNumber: 15; SheetTotal: 17
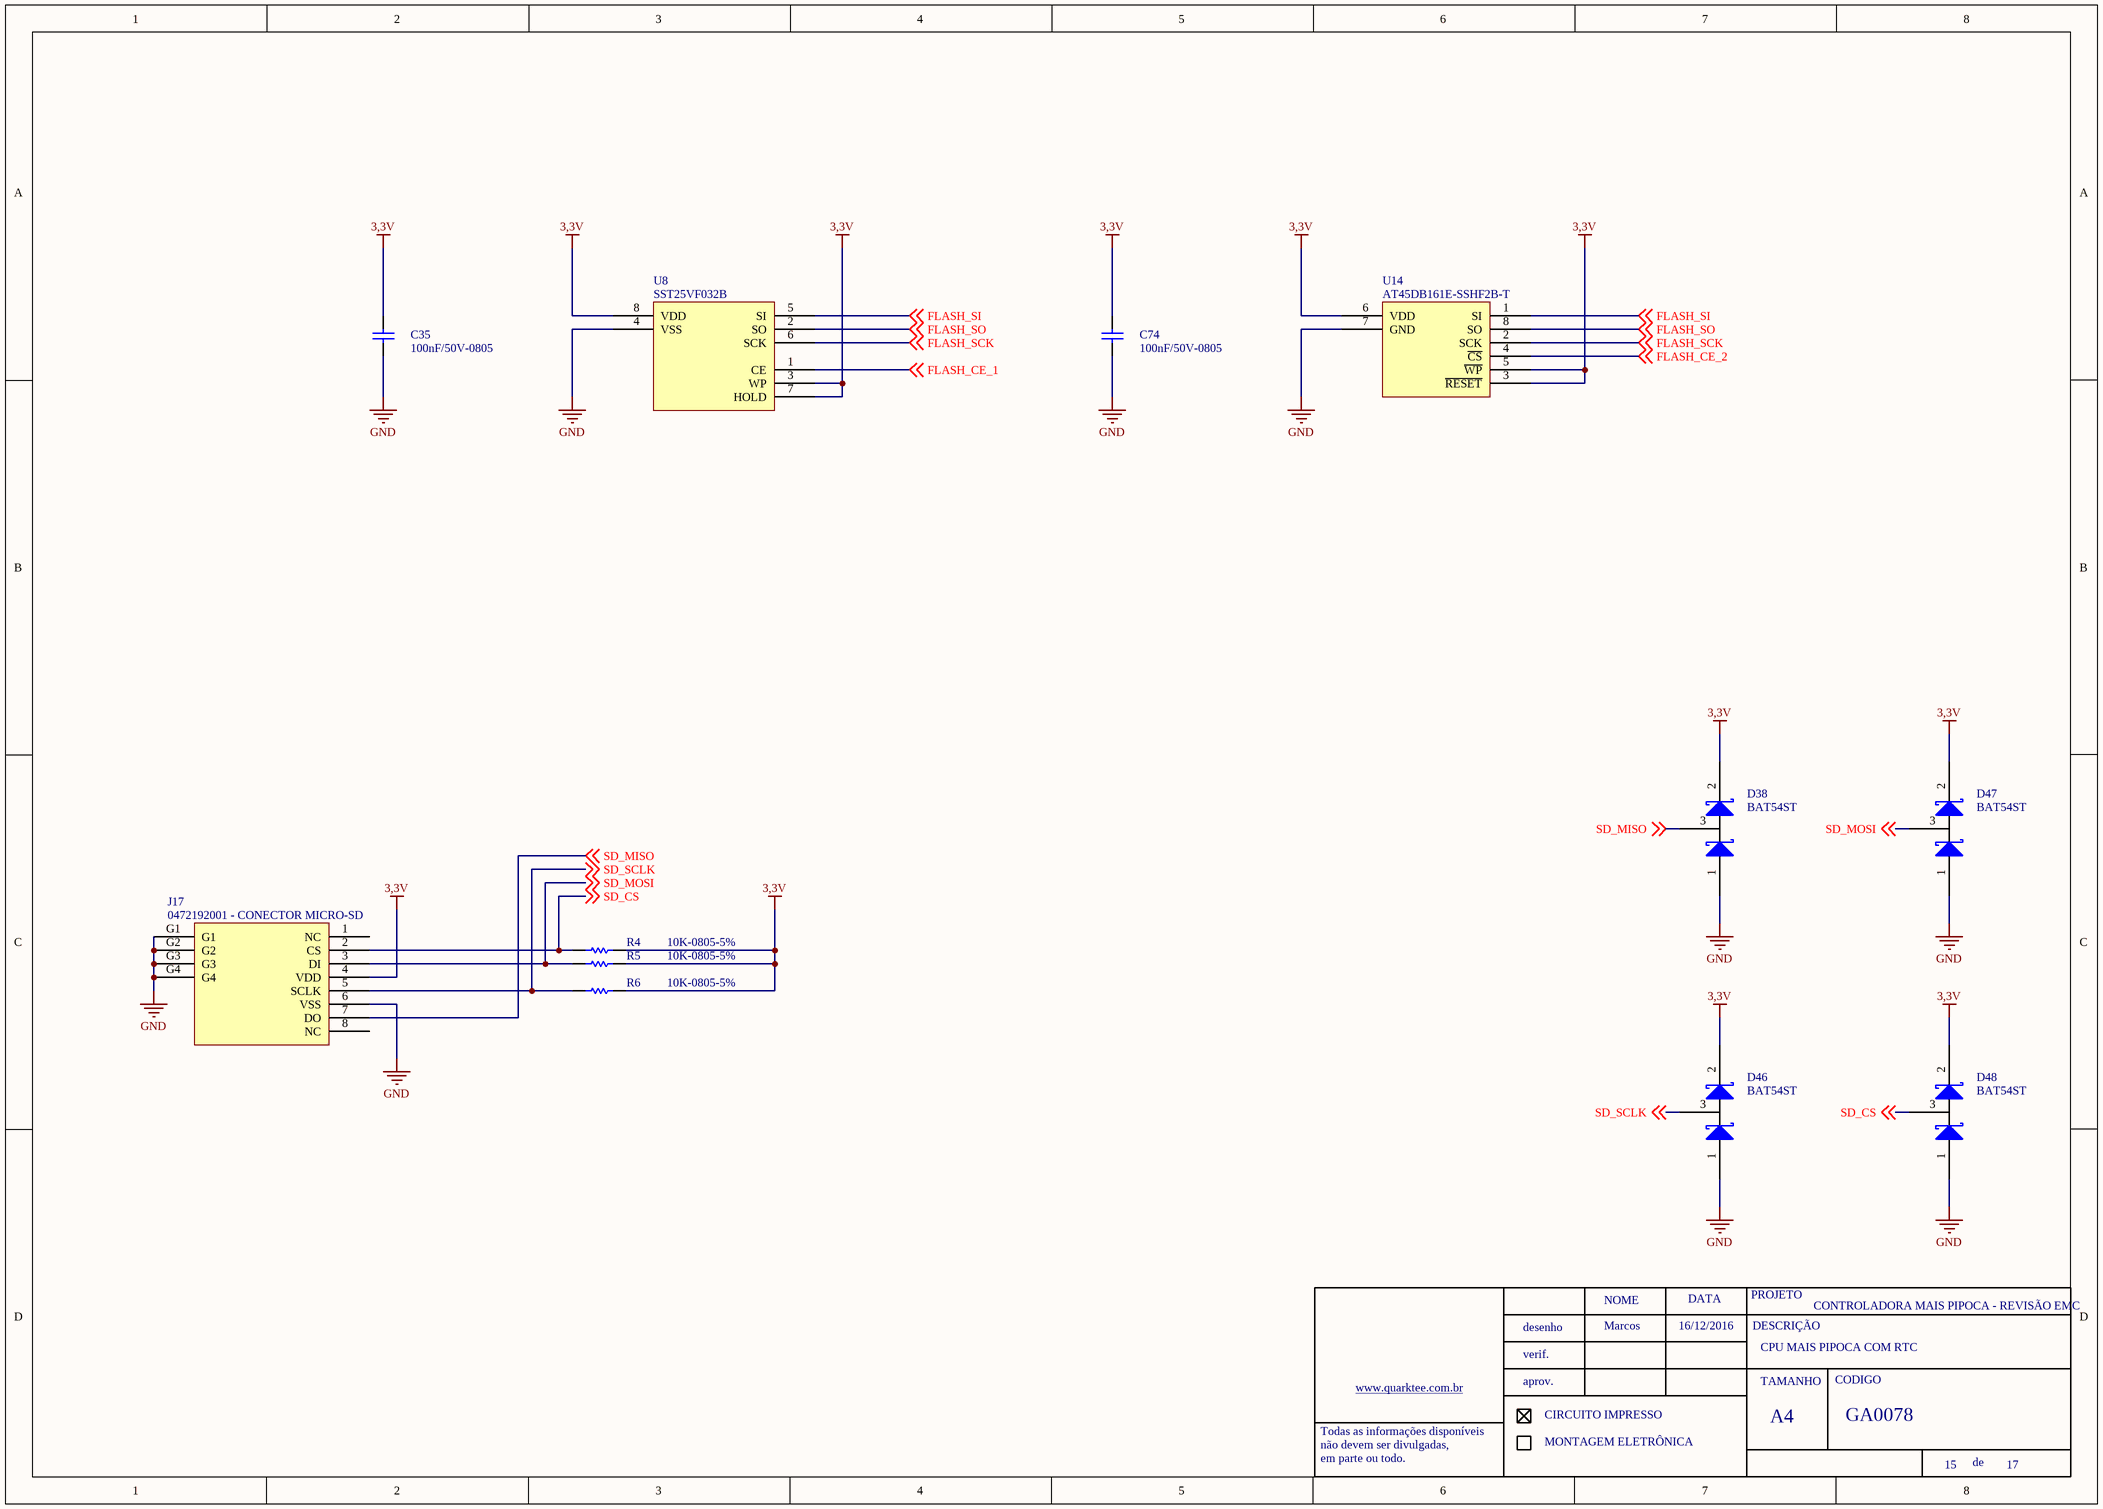
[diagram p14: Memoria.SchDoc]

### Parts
C35  100nF/50V-0805  [0805-REVISADO ONDA]
C74  100nF/50V-0805  [0805-REVISADO ONDA]
D38  BAT54ST  [SOT23 - REVISADO ONDA]
D46  BAT54ST  [SOT23 - REVISADO ONDA]
D47  BAT54ST  [SOT23 - REVISADO ONDA]
D48  BAT54ST  [SOT23 - REVISADO ONDA]
J17  0472192001 - CONECTOR MICRO-SD
R4  10K-0805-5%  [0805-REVISADO ONDA]
R5  10K-0805-5%  [0805-REVISADO ONDA]
R6  10K-0805-5%  [0805-REVISADO ONDA]
U8  SST25VF032B  [SOIC LARGO ATMEL]
U14  AT45DB161E-SSHF2B-T

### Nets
3,3V: C35.2 C74.2 D38.2 D46.2 D47.2 D48.2 J17.4(VDD) R4.1 R5.1 R6.1 U8.3(WP) U8.7(HOLD) U8.8(VDD) U14.3(~{RESET}) U14.5(~{WP}) U14.6(VDD)
GND: C35.1 C74.1 D38.1 D46.1 D47.1 D48.1 J17.6(VSS) J17.G1 J17.G2 J17.G3 J17.G4 U8.4(VSS) U14.7(GND)
FLASH_CE_1: U8.1(CE) ; off-sheet FLASH_CE_1
FLASH_CE_2: U14.4(~{CS}) ; off-sheet FLASH_CE_2
FLASH_SCK: U8.6(SCK) U14.2(SCK) ; off-sheet FLASH_SCK
FLASH_SI: U8.5(SI) U14.1(SI) ; off-sheet FLASH_SI
FLASH_SO: U8.2(SO) U14.8(SO) ; off-sheet FLASH_SO
SD_CS: D48.3 J17.2(CS) R4.2 ; off-sheet SD_CS
SD_MISO: D38.3 J17.7(DO) ; off-sheet SD_MISO
SD_MOSI: D47.3 J17.3(DI) R5.2 ; off-sheet SD_MOSI
SD_SCLK: D46.3 J17.5(SCLK) R6.2 ; off-sheet SD_SCLK

Not connected (* = marked no-connect by the designer): J17 1(NC) 8(NC)

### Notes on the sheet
- Marcos
- 16/12/2016
- CPU MAIS PIPOCA COM RTC

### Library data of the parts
C35 C74 = 100nF/50-0805-NPO
J17 = CONECTOR MICRO-SD
U8 = SST25VF032B: ERP: FALTA CADASTRAR

## Sheet Porta_MDB.SchDoc: CONTROLADORA MAIS PIPOCA - REVISÃO EMC
size A3; DocumentNumber: GA0078; SheetNumber: 14; SheetTotal: 17
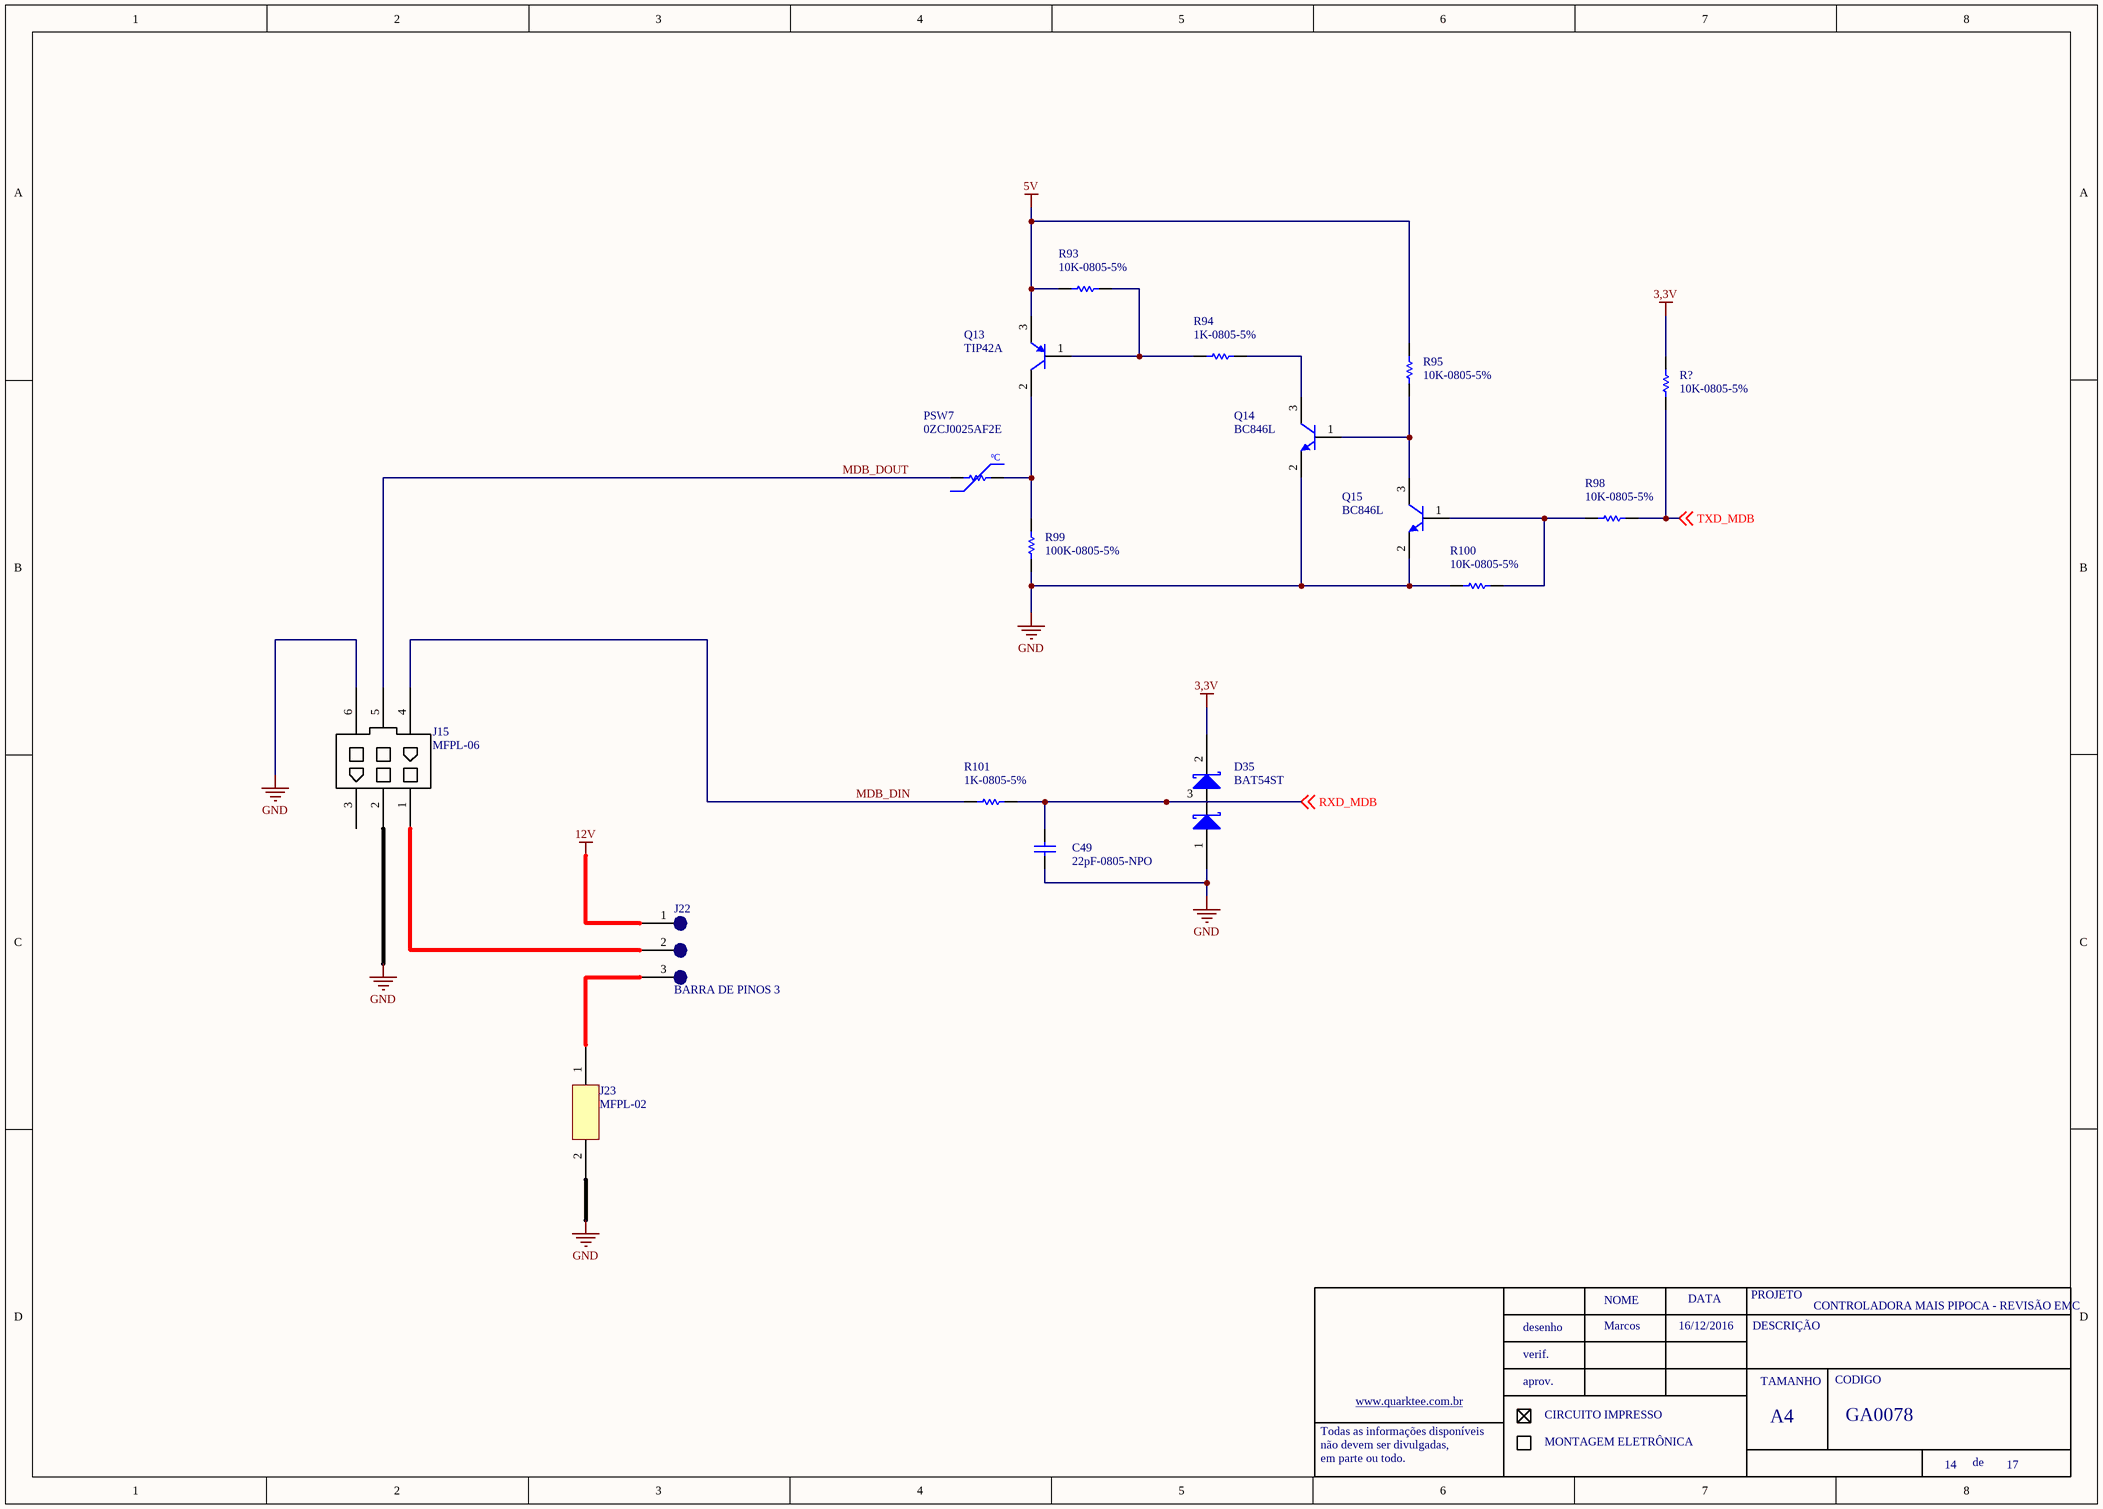
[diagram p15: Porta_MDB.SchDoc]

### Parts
C49  22pF-0805-NPO  [0805-REVISADO ONDA]
D35  BAT54ST  [SOT23 - REVISADO ONDA]
J15  MFPL-06
J22  BARRA DE PINOS 3
J23  MFPL-02
PSW7  0ZCJ0025AF2E  [1206-REVISADO ONDA]
Q13  TIP42A  [DPAK REVISADO ONDA]
Q14  BC846L  [SOT23 - REVISADO ONDA]
Q15  BC846L  [SOT23 - REVISADO ONDA]
R93  10K-0805-5%  [0805-REVISADO ONDA]
R94  1K-0805-5%  [0805-REVISADO ONDA]
R95  10K-0805-5%  [0805-REVISADO ONDA]
R98  10K-0805-5%  [0805-REVISADO ONDA]
R99  100K-0805-5%  [0805-REVISADO ONDA]
R100  10K-0805-5%  [0805-REVISADO ONDA]
R101  1K-0805-5%  [0805-REVISADO ONDA]
R?  10K-0805-5%  [0805-REVISADO ONDA]

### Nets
3,3V: D35.2 R?.2
5V: Q13.3(E) R93.1 R95.2
12V: J22.1
GND: C49.1 D35.1 J15.2 J15.6 J23.2 Q14.2(E) Q15.2(E) R99.1 R100.1
MDB_DIN: J15.4 R101.1
MDB_DOUT: J15.5 PSW7.1
RXD_MDB: C49.2 D35.3 R101.2 ; off-sheet RXD_MDB
TXD_MDB: R98.2 R?.1 ; off-sheet TXD_MDB
NetJ15_1: J15.1 J22.2
NetJ22_3: J22.3 J23.1
NetPSW7_2: PSW7.2 Q13.2(C) R99.2
NetQ13_1: Q13.1(B) R93.2 R94.1
NetQ14_1: Q14.1(B) Q15.3(C) R95.1
NetQ14_3: Q14.3(C) R94.2
NetQ15_1: Q15.1(B) R98.1 R100.2

Not connected (* = marked no-connect by the designer): J15 3

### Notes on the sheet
- Marcos
- 16/12/2016

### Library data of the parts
J22 = JUMPER 3
PSW7 = PTC 2A-120V
Q14 Q15 = BC846

## Sheet Regulador.SchDoc: GRUPO ALTECH
size A3; DocumentNumber: GA0078; SheetNumber: 16; SheetTotal: 16
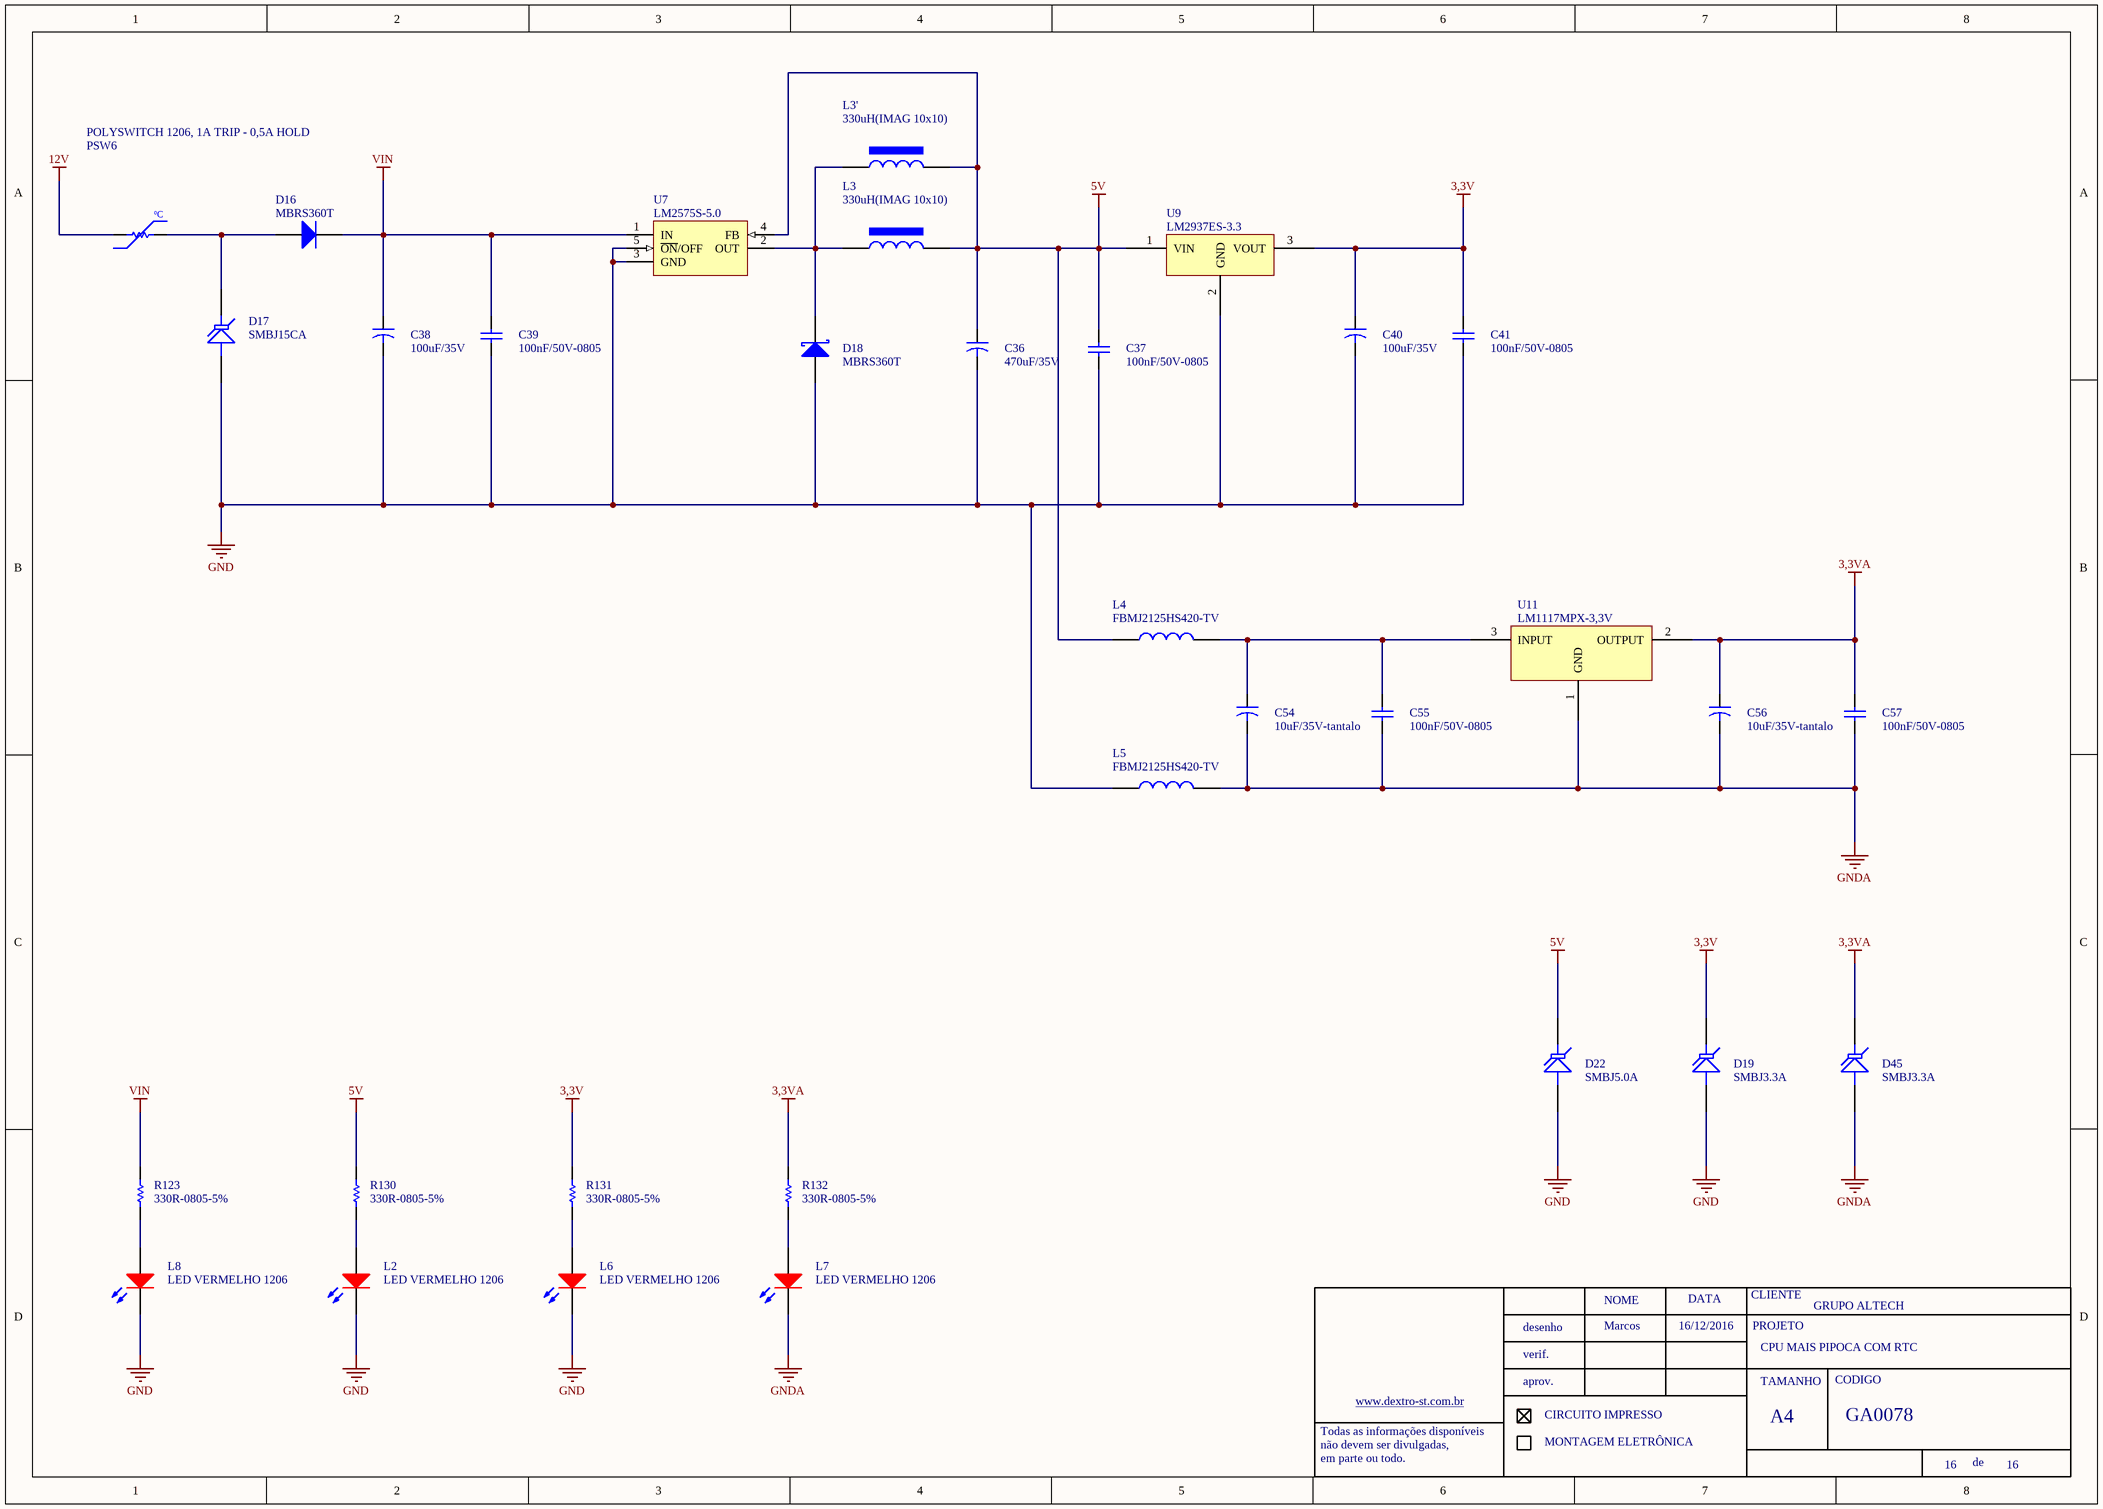
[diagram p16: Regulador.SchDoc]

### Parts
C36  470uF/35V  [CAP POL 8x12mm]
C37  100nF/50V-0805  [0805-REVISADO ONDA]
C38  100uF/35V  [CAP POL 8x12mm]
C39  100nF/50V-0805  [0805-REVISADO ONDA]
C40  100uF/35V  [CAP POL 8x12mm]
C41  100nF/50V-0805  [0805-REVISADO ONDA]
C54  10uF/35V-tantalo  [tantalo vishay E]
C55  100nF/50V-0805  [0805-REVISADO ONDA]
C56  10uF/35V-tantalo  [tantalo vishay E]
C57  100nF/50V-0805  [0805-REVISADO ONDA]
D16  MBRS360T  [DO-214AB]
D17  SMBJ15CA  [DO-214AA]
D18  MBRS360T  [DO-214AB]
D19  SMBJ3.3A  [DO-214AA]
D22  SMBJ5.0A  [DO-214AA]
D45  SMBJ3.3A  [DO-214AA]
L2  LED VERMELHO 1206  [LED 1206]
L3  330uH(IMAG 10x10)  [INDUTOR 47mH]
L3'  330uH(IMAG 10x10)  [INDUTOR 47mH]
L4  FBMJ2125HS420-TV  [0805-REVISADO ONDA]
L5  FBMJ2125HS420-TV  [0805-REVISADO ONDA]
L6  LED VERMELHO 1206  [LED 1206]
L7  LED VERMELHO 1206  [LED 1206]
L8  LED VERMELHO 1206  [LED 1206]
PSW6  POLYSWITCH 1206, 1A TRIP - 0,5A HOLD  [1206-REVISADO ONDA]
R123  330R-0805-5%  [0805-REVISADO ONDA]
R130  330R-0805-5%  [0805-REVISADO ONDA]
R131  330R-0805-5%  [0805-REVISADO ONDA]
R132  330R-0805-5%  [0805-REVISADO ONDA]
U7  LM2575S-5.0  [TO-263-5]
U9  LM2937ES-3.3  [TO-263]
U11  LM1117MPX-3,3V  [SOT223]

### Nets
3,3V: C40.1 C41.2 D19.2(K) R131.2 U9.3(VOUT)
3,3VA: C56.1 C57.2 D45.2(K) R132.2 U11.2(OUTPUT)
5V: C36.1 C37.2 D22.2(K) L3.1 L3'.1 L4.1 R130.2 U7.4(FB) U9.1(VIN)
12V: PSW6.1
GND: C36.2 C37.1 C38.2 C39.1 C40.2 C41.1 D17.1(A) D18.1(A) D19.1(A) D22.1(A) L2.2(K) L5.1 L6.2(K) L8.2(K) U7.3(GND) U7.5(~{ON}/OFF) U9.2(GND)
GNDA: C54.2 C55.1 C56.2 C57.1 D45.1(A) L5.2 L7.2(K) U11.1(GND)
VIN: C38.1 C39.2 D16.2(K) R123.2 U7.1(IN)
NetC54_1: C54.1 C55.2 L4.2 U11.3(INPUT)
NetD16_1: D16.1(A) D17.2(K) PSW6.2
NetD18_2: D18.2(K) L3.2 L3'.2 U7.2(OUT)
NetL2_1: L2.1(A) R130.1
NetL6_1: L6.1(A) R131.1
NetL7_1: L7.1(A) R132.1
NetL8_1: L8.1(A) R123.1

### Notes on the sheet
- Marcos
- 16/12/2016
- CPU MAIS PIPOCA COM RTC

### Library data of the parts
C36 C38 C40 = 100uF/50V
C37 C39 C41 C55 C57 = 100nF/50-0805-NPO
D16 = 1N4007
D17 = SMBJ30.0A
D18 = 1N5819-SOD80
D19 D45 = SMBJ5.0A
L2 L6-L8 = LED VERMELHO 0603 SMD
L3 L3' = indutor 1mH CNF15: 1mH-CNF15-26 AWG
L4 L5 = FERRITE BEAD 2K7-100MHZ - 200 mA - 800mOHM DC
PSW6 = PTC 2A-120V
R123 R130-R132 = 1K-0805-5%
U9 = LM3940IT-3.3-TO220: LM2937
U11 = LM1117MPX-3,3V-SOT223

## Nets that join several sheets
3,3V: Barreira_pacote (D15.2), Controle_Cupula (D2.2 R7.2), Controle_placa_potencia (D4.2 D5.2), ControleEmbalagem (5 pins), ControleLeds (C7.2 U2.10 U2.16), CPU (17 pins), Entrada_comestero_rm5 (12 pins), IHM (R25.1 R26.1 R27.1 R28.1), Interface_gratis (D40.2 R105.2), InterfaceConfiguracao (C27.2 C51.2 U6.16), JTAG (10 pins), Meios_pagamento (D13.2 D14.2 R40.2 R41.2), Memoria (16 pins), Porta_MDB (D35.2 R?.2), Regulador (5 pins)
3,3VA: Controle_placa_potencia (D7.2 R16.2), CPU (U4.10 U4.12), Regulador (5 pins)
5V: amplificadorAudio (R80.1), Barreira_pacote (R57.2 R58.2), ControleEmbalagem (J4.4), IHM (7 pins), InterfaceConfiguracao (C72.2 U10.16 U13.4 U13.20), Porta_MDB (Q13.3 R93.1 R95.2), Regulador (9 pins)
12V: amplificadorAudio (6 pins), Barreira_pacote (J11.1), Controle_Cupula (PSW1.2), Controle_placa_potencia (J3.1), ControleEmbalagem (J4.1), ControleLeds (J5.1 J6.1 J20.1), Entrada_comestero_rm5 (J13.2 Q11.2 R67.1), Interface_gratis (J18.1), JTAG (J16.1), Meios_pagamento (J8.1 J9.1), Porta_MDB (J22.1), Regulador (PSW6.1)
GND: amplificadorAudio (30 pins), Barreira_pacote (5 pins), Controle_Cupula (13 pins), Controle_placa_potencia (5 pins), ControleEmbalagem (10 pins), ControleLeds (10 pins), CPU (20 pins), Entrada_comestero_rm5 (15 pins), IHM (13 pins), Interface_gratis (5 pins), InterfaceConfiguracao (27 pins), JTAG (18 pins), Meios_pagamento (10 pins), Memoria (13 pins), Porta_MDB (9 pins), Regulador (17 pins)
GNDA: Controle_placa_potencia (C11.1 D7.1 R18.1), CPU (U4.11 U4.15), Regulador (8 pins)
AUDIO: amplificadorAudio (R1.1), CPU (U4.6)
BOTAO_GRATIS: CPU (U4.27), Interface_gratis (D40.3 R106.2)
DEC: CPU (U4.90), IHM (R27.2 S3.2)
ENTER: CPU (U4.89), IHM (R28.2 S4.2)
ESC: CPU (U4.92), IHM (R25.2 S1.2)
FIM_DO_PAPEL: ControleEmbalagem (C12.2 D8.3 R19.2), CPU (U4.8)
FLASH_CE_1: CPU (U4.63), Memoria (U8.1)
FLASH_CE_2: CPU (U4.57), Memoria (U14.4)
FLASH_SCK: CPU (U4.62), Memoria (U8.6 U14.2)
FLASH_SI: CPU (U4.60), Memoria (U8.5 U14.1)
FLASH_SO: CPU (U4.61), Memoria (U8.2 U14.8)
H_DIR_EMB: Controle_Cupula (R112.1), CPU (U4.21)
H_ES_EMB: Controle_Cupula (R111.1), CPU (U4.44)
INC: CPU (U4.91), IHM (R26.2 S2.2)
INHIBIT_P70: CPU (U4.39), Meios_pagamento (R54.2)
INHIBIT_UCA1: CPU (U4.38), Meios_pagamento (R53.2)
L_DIR_EMB: Controle_Cupula (R116.1), CPU (U4.20)
L_ES_EMB: Controle_Cupula (R115.1), CPU (U4.45)
LCD2_D4: CPU (U4.67), IHM (U5.4)
LCD2_D5: CPU (U4.66), IHM (U5.5)
LCD2_D6: CPU (U4.65), IHM (U5.6)
LCD2_D7: CPU (U4.64), IHM (U5.7)
LCD2_ENABLE: CPU (U4.69), IHM (U5.3)
LCD2_RS: CPU (U4.68), IHM (U5.2)
LCD_D4: CPU (U4.93), IHM (R34.2)
LCD_D5: CPU (U4.94), IHM (R32.2)
LCD_D6: CPU (U4.80), IHM (R31.2)
LCD_D7: CPU (U4.81), IHM (R30.2)
LCD_ENABLE: CPU (U4.86), IHM (LCD1.6)
LCD_RS: CPU (U4.7), IHM (LCD1.4)
LED_GRATIS: CPU (U4.26), Interface_gratis (R107.1)
LEDS_CLOCK: ControleLeds (U2.11), CPU (U4.36)
LEDS_DATA: ControleLeds (U2.14), CPU (U4.34)
LEDS_STROBE: ControleLeds (U2.12), CPU (U4.35)
LIGA_NEUTRO_POT: Controle_placa_potencia (R14.1), CPU (U4.33)
MOTOR_EMBALAGEM: ControleEmbalagem (R24.2), IHM (U5.12)
P_FITA_LED_DIR: ControleLeds (R38.1), CPU (U4.85)
P_FITA_LED_ESQ: ControleLeds (R36.1), CPU (U4.82)
PULSO_CONT_MOTOR: Controle_placa_potencia (R13.1), CPU (U4.70)
PULSO_CONT_RES: Controle_placa_potencia (R12.2), CPU (U4.73)
PULSO_MOEDE_UCA1: CPU (U4.51), Meios_pagamento (C32.2 D13.3 R42.1)
PULSO_NOTEI_P70: CPU (U4.50), Meios_pagamento (C33.2 D14.3 R43.2)
REED_DOSADOR: Controle_Cupula (D2.3 R8.2), CPU (U4.88)
RESET: CPU (U4.17), JTAG (5 pins)
RM5_CH1: CPU (U4.59), Entrada_comestero_rm5 (D24.3 R74.2)
RM5_CH2: CPU (U4.58), Entrada_comestero_rm5 (D28.3 R79.2)
RM5_CH3: CPU (U4.25), Entrada_comestero_rm5 (D32.3 R91.2)
RM5_CH4: CPU (U4.24), Entrada_comestero_rm5 (D26.3 R75.2)
RM5_CH5: CPU (U4.29), Entrada_comestero_rm5 (D30.3 R84.2)
RM5_CH6: CPU (U4.30), Entrada_comestero_rm5 (D34.3 R92.2)
RM5_INHIBIT: CPU (U4.40), Entrada_comestero_rm5 (R70.2)
RTCK: CPU (U4.100), JTAG (J12.11 J14.2)
RXD_MDB: CPU (U4.49), Porta_MDB (C49.2 D35.3 R101.2)
RXD_MOEDEIRO: Barreira_pacote (D15.3 R59.2), CPU (U4.99)
RXD_PROG: CPU (R64.1 U4.47), InterfaceConfiguracao (U10.3)
SAIDA_01: CPU (U4.95), IHM (U5.8)
SAIDA_PAPEL: ControleEmbalagem (D11.3 R23.2), CPU (U4.37)
SD_CS: CPU (U4.79), Memoria (D48.3 J17.2 R4.2)
SD_MISO: CPU (U4.77), Memoria (D38.3 J17.7)
SD_MOSI: CPU (U4.76), Memoria (D47.3 J17.3 R5.2)
SD_SCLK: CPU (U4.78), Memoria (D46.3 J17.5 R6.2)
SEL_PROG_DEX_A: CPU (U4.43), InterfaceConfiguracao (U10.10)
SEL_PROG_DEX_B: CPU (U4.56), InterfaceConfiguracao (U10.9)
SINAL_RPM: Controle_placa_potencia (C10.1 D5.3 R15.2), CPU (U4.32)
SINCRONISMO_60HZ: Controle_placa_potencia (C9.1 D4.3 R11.2), CPU (U4.52)
TCK: CPU (U4.5), JTAG (J12.9 R51.1)
TDI: CPU (U4.2), JTAG (J12.5 R46.2)
TDO: CPU (U4.1), JTAG (J12.13 R44.2)
TELET_RXD: CPU (U4.74), JTAG (D37.3 R102.2)
TELET_TXD: CPU (U4.75), JTAG (D36.3 R97.2)
TEMPERATURA: Controle_placa_potencia (C11.2 D7.3 R17.2), CPU (U4.9)
TMS: CPU (U4.3), JTAG (J12.7 R45.2)
TRSTN: CPU (U4.4), JTAG (J12.3 R47.2)
TXD_MDB: CPU (U4.48), Porta_MDB (R98.2 R?.1)
TXD_MOEDEIRO: Barreira_pacote (R60.2), CPU (U4.98)
TXD_PROG: CPU (R63.1 U4.46), InterfaceConfiguracao (U10.13)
